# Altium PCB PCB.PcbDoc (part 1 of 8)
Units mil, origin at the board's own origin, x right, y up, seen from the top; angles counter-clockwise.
Board outline 11229.24 x 7764.43 mil, 14 copper layers (Top Layer, GND1, Signal 1, GND2, Signal 2, GND3, Singal 3, Power 1, GND4, Power 2, GND5, Power 3, GND6, Bottom Layer), stack 91.892 mil thick; 877 components, 305 nets, 2660 pads, 2851 vias.
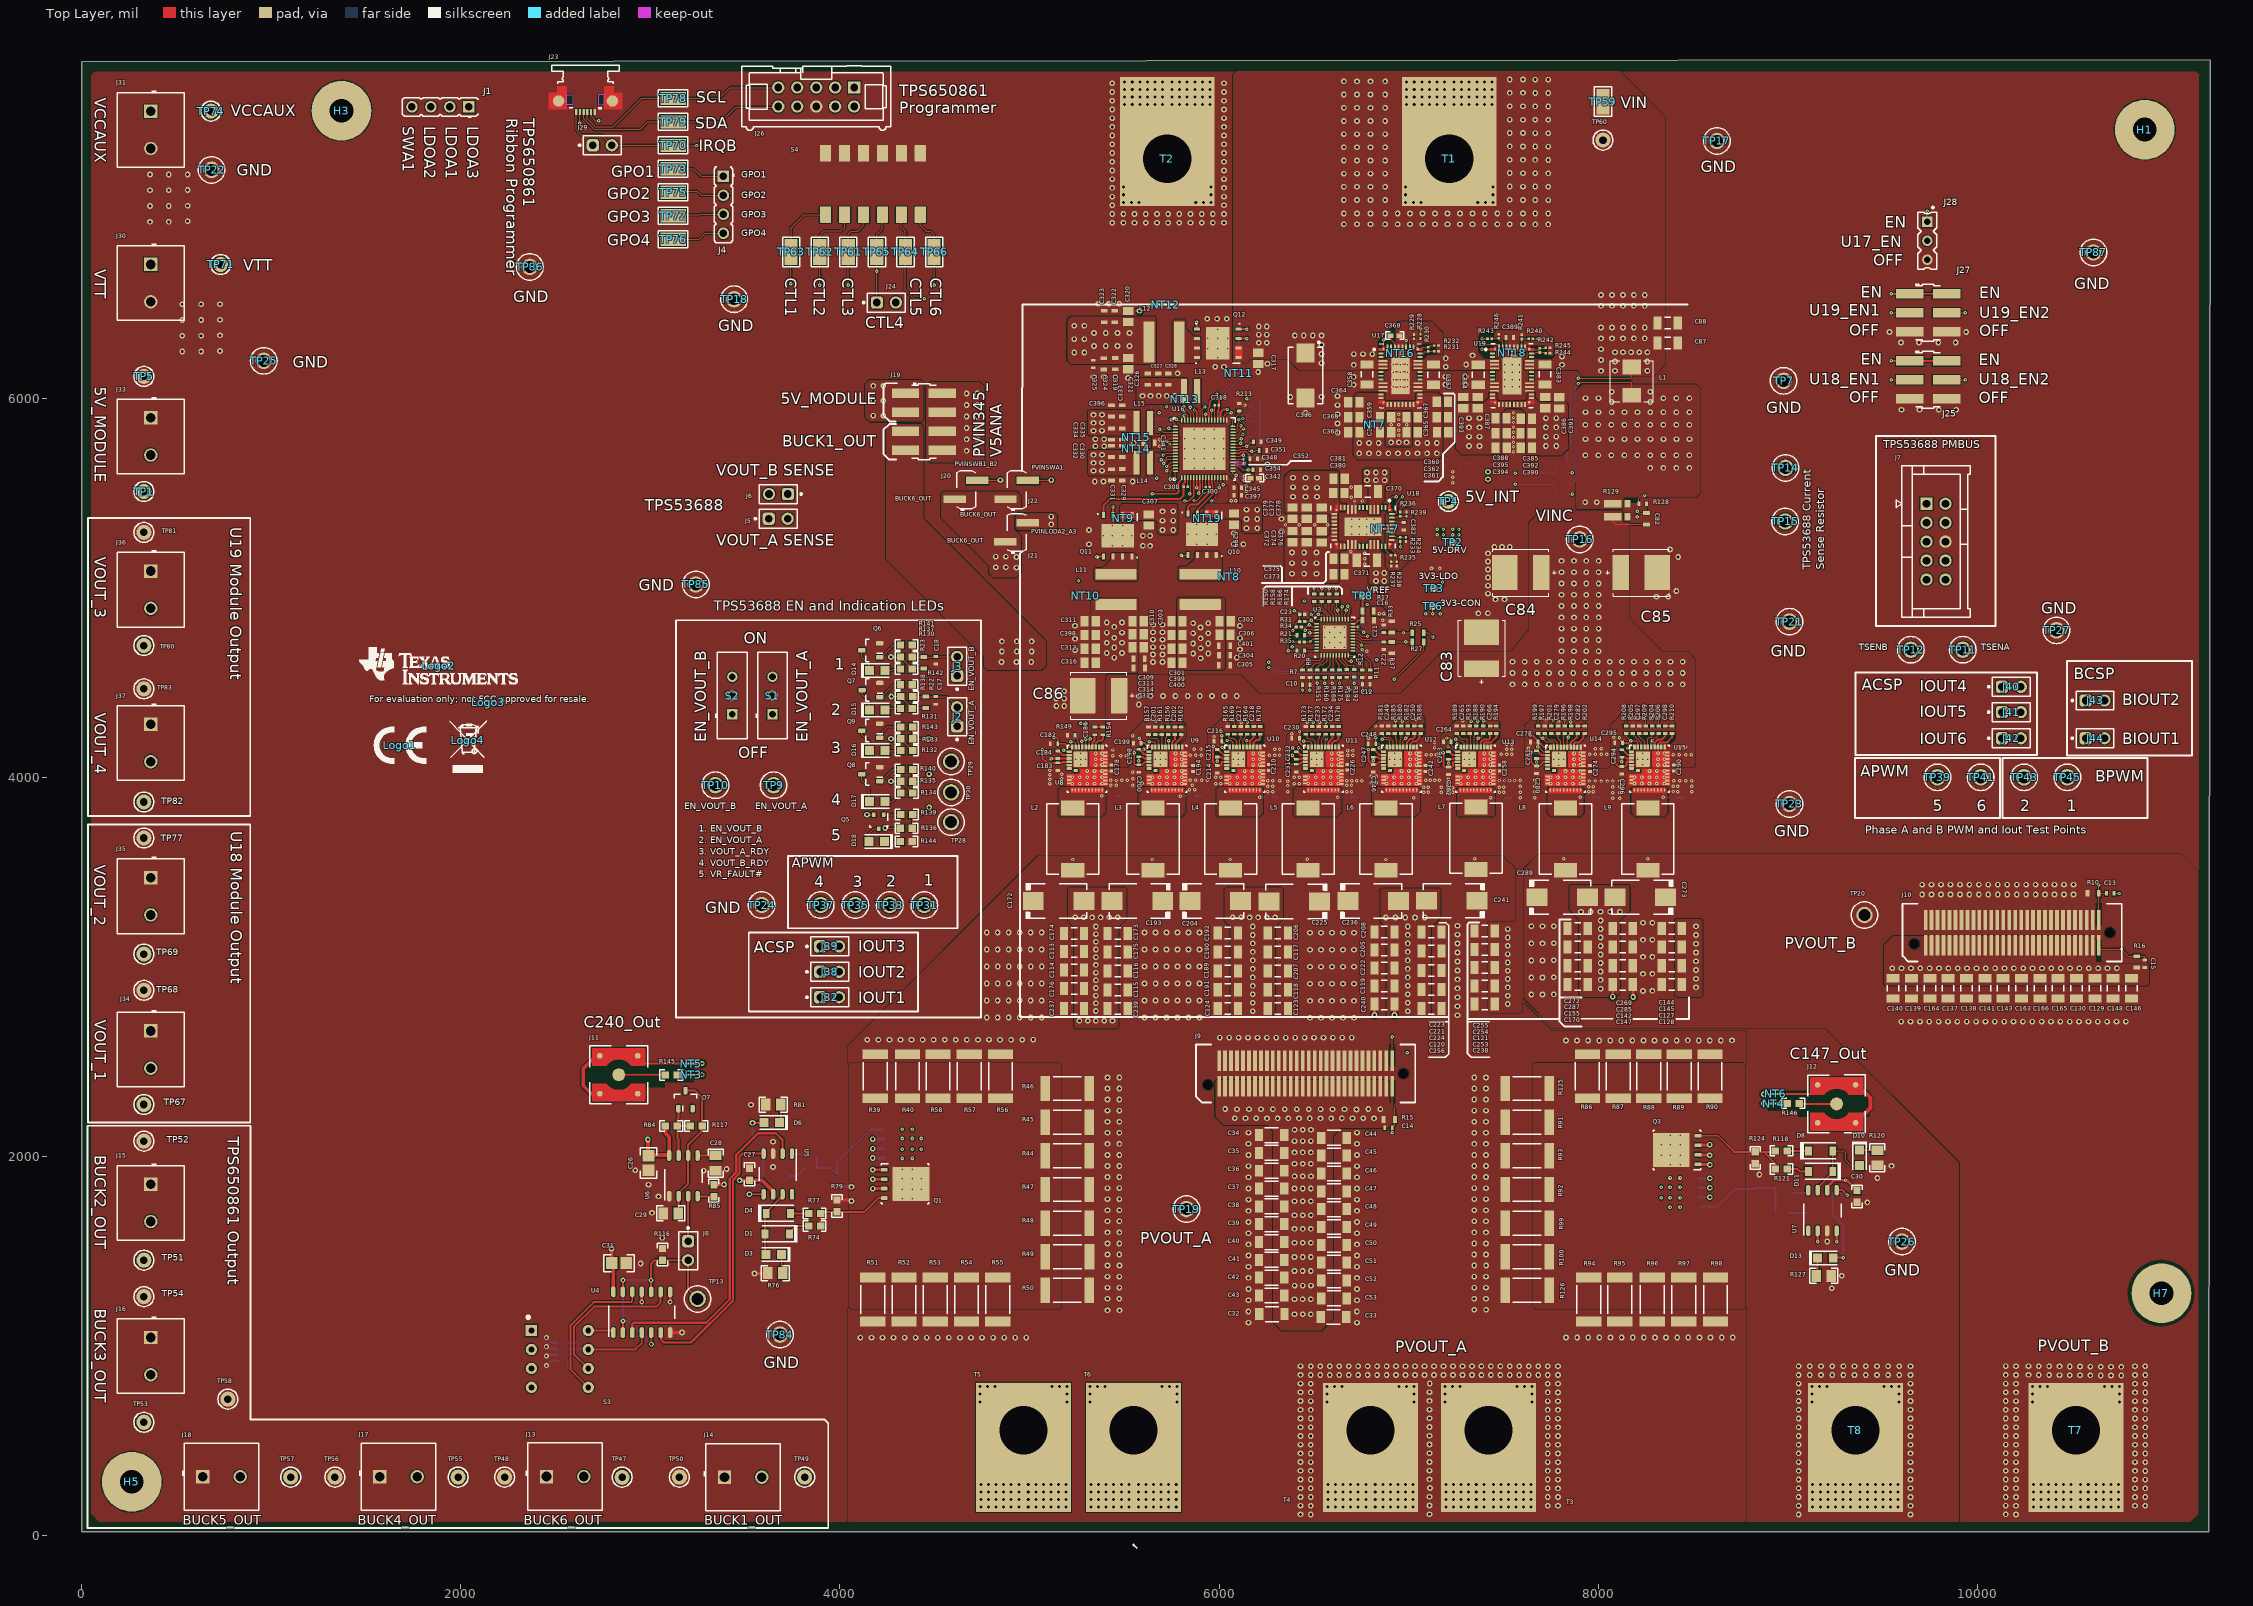
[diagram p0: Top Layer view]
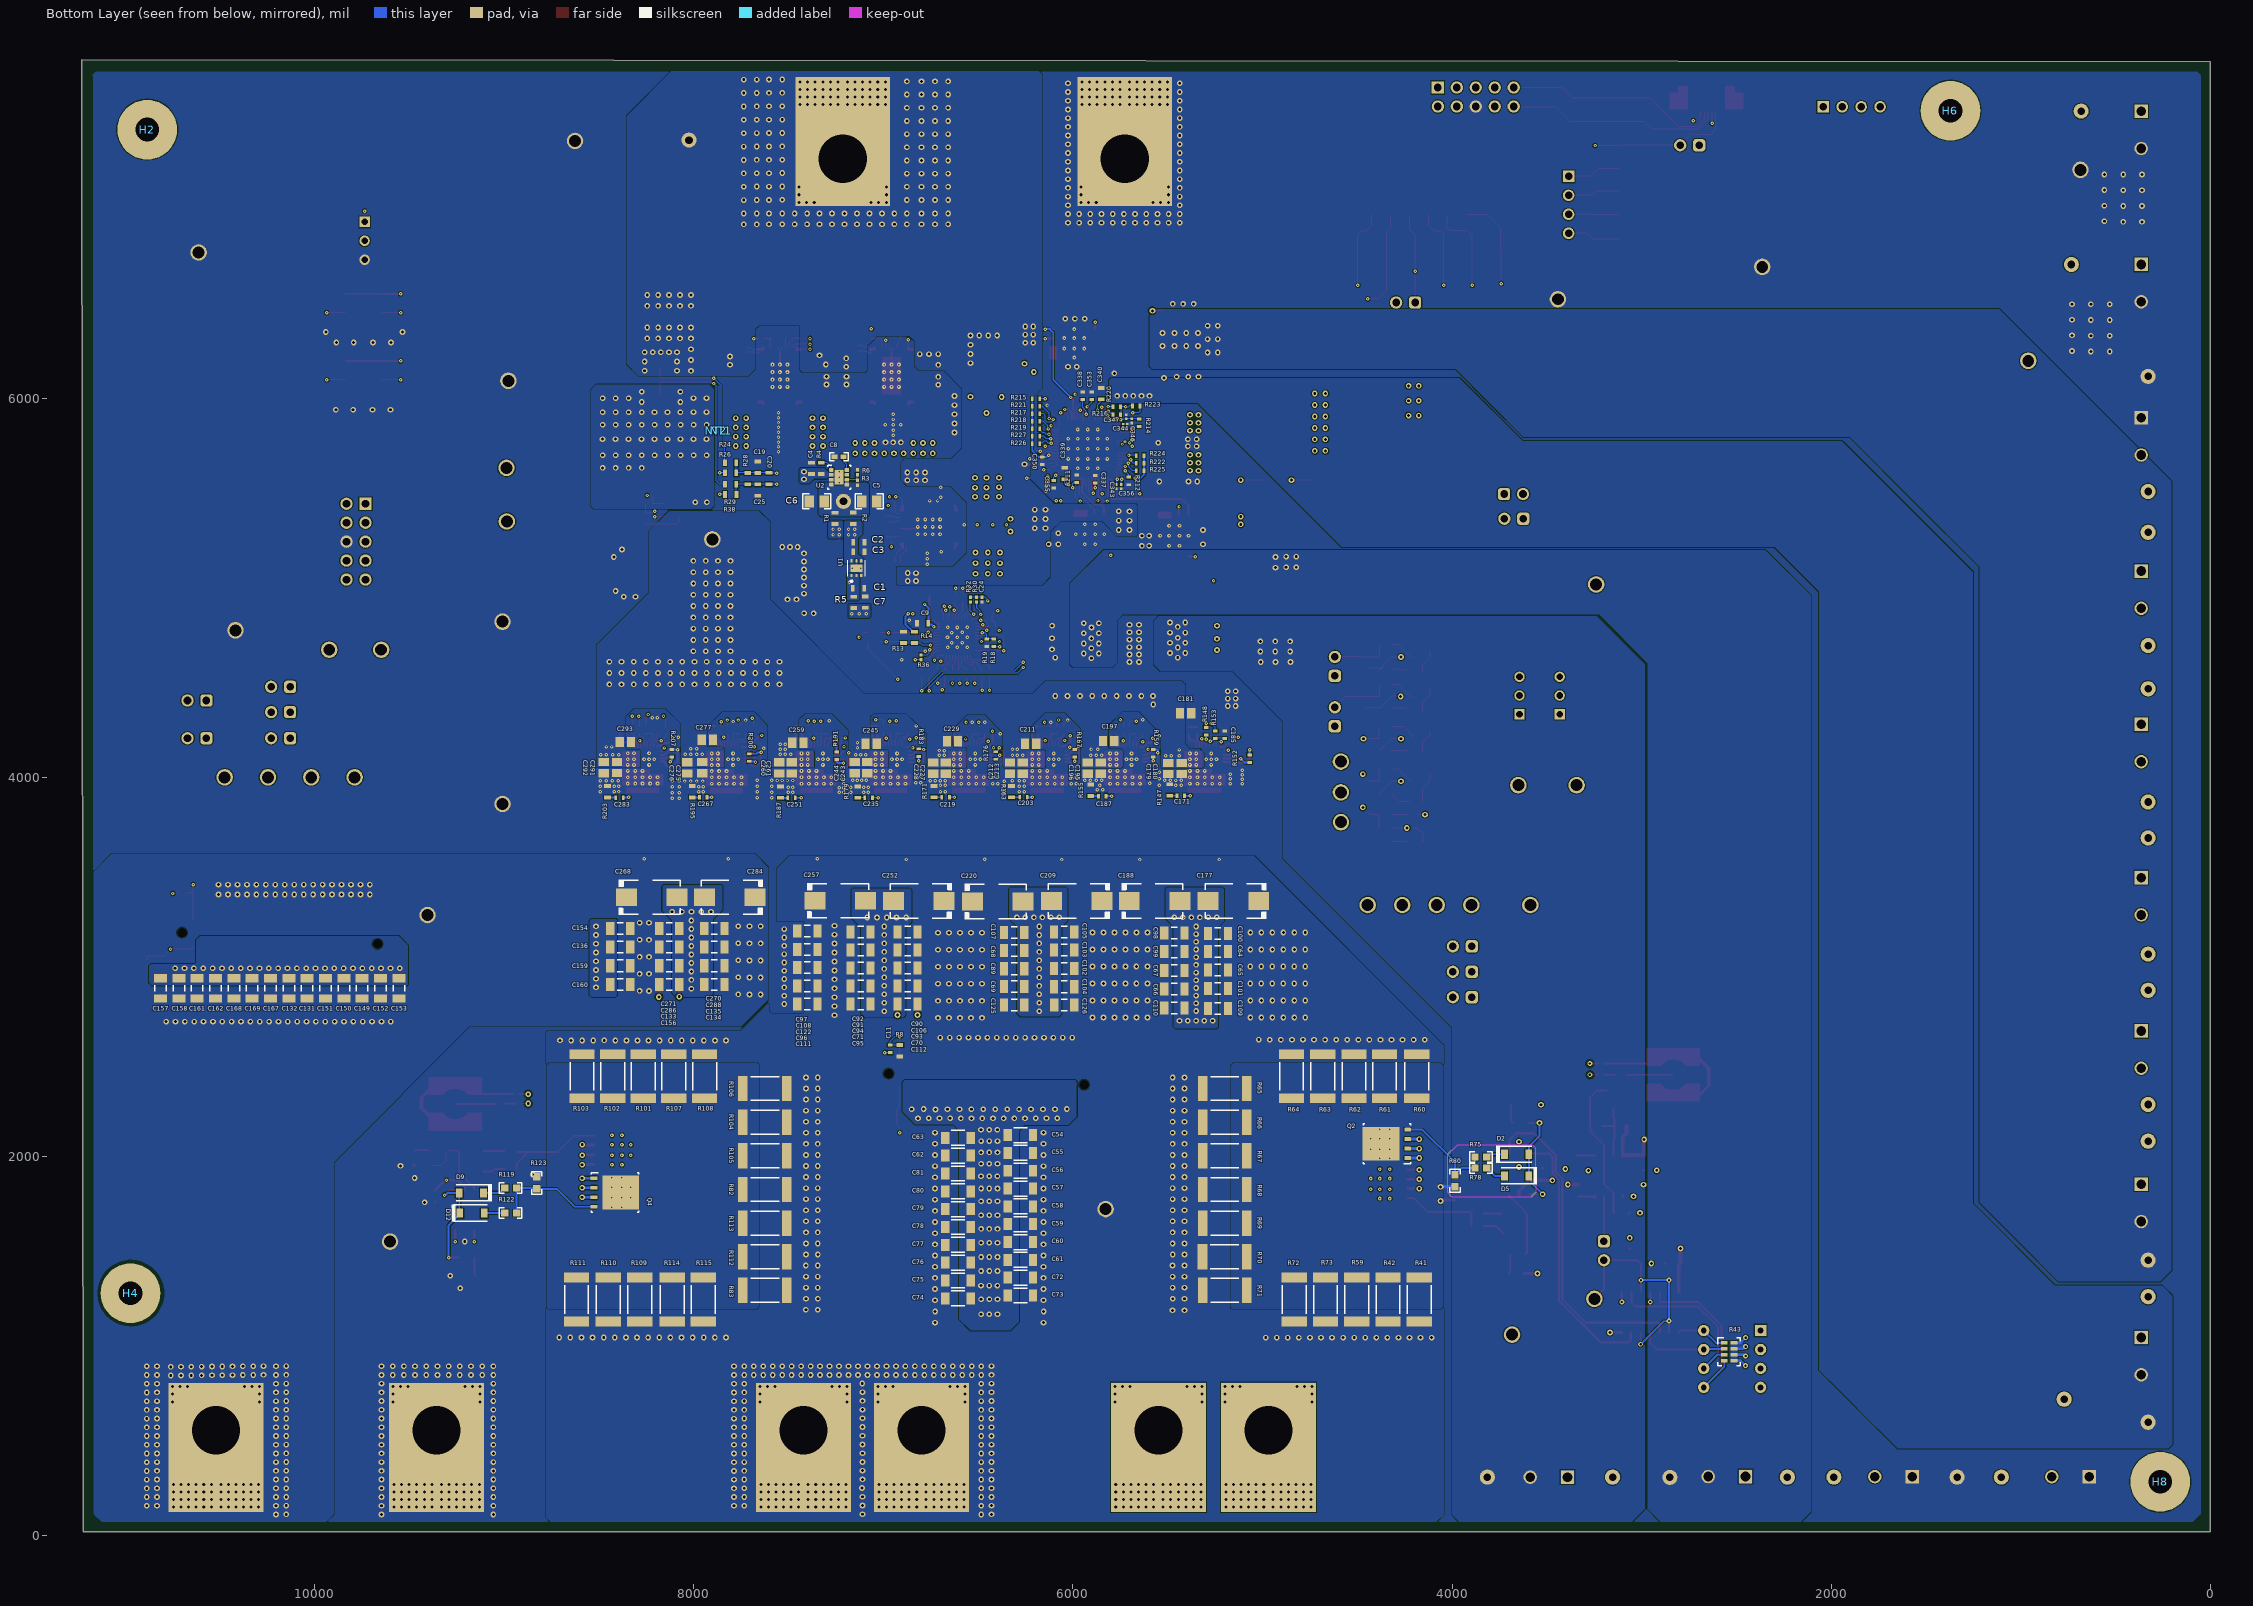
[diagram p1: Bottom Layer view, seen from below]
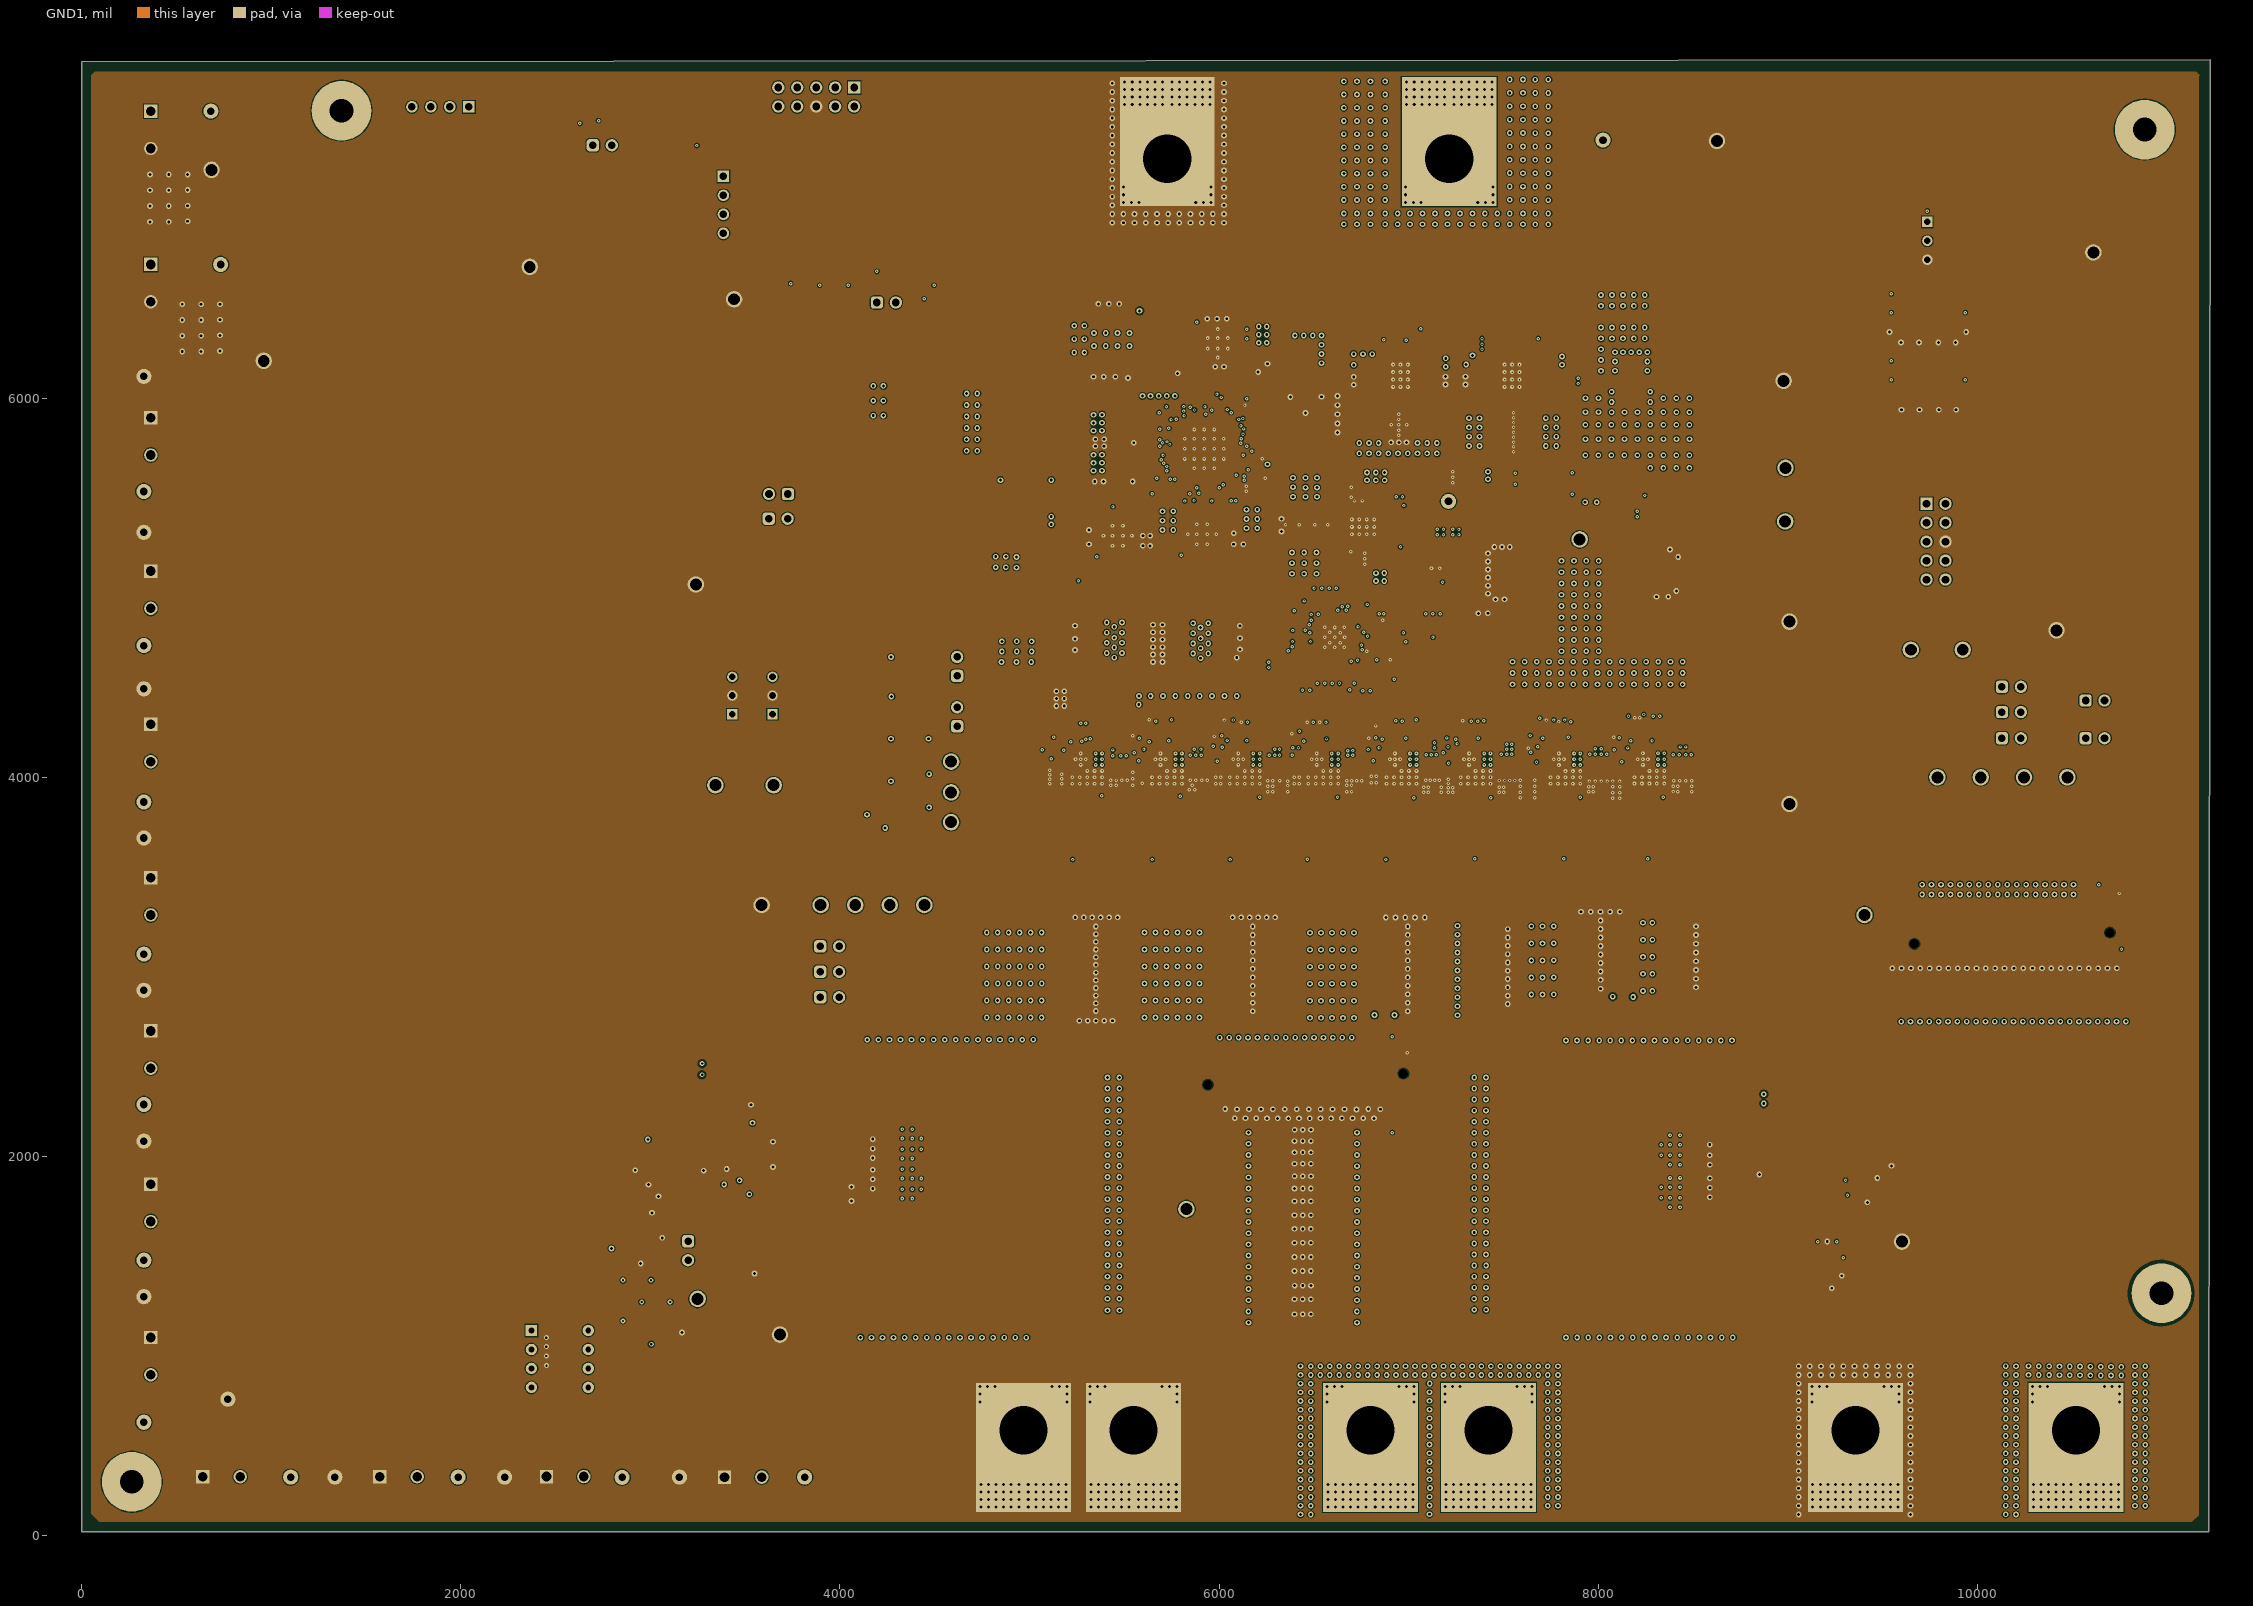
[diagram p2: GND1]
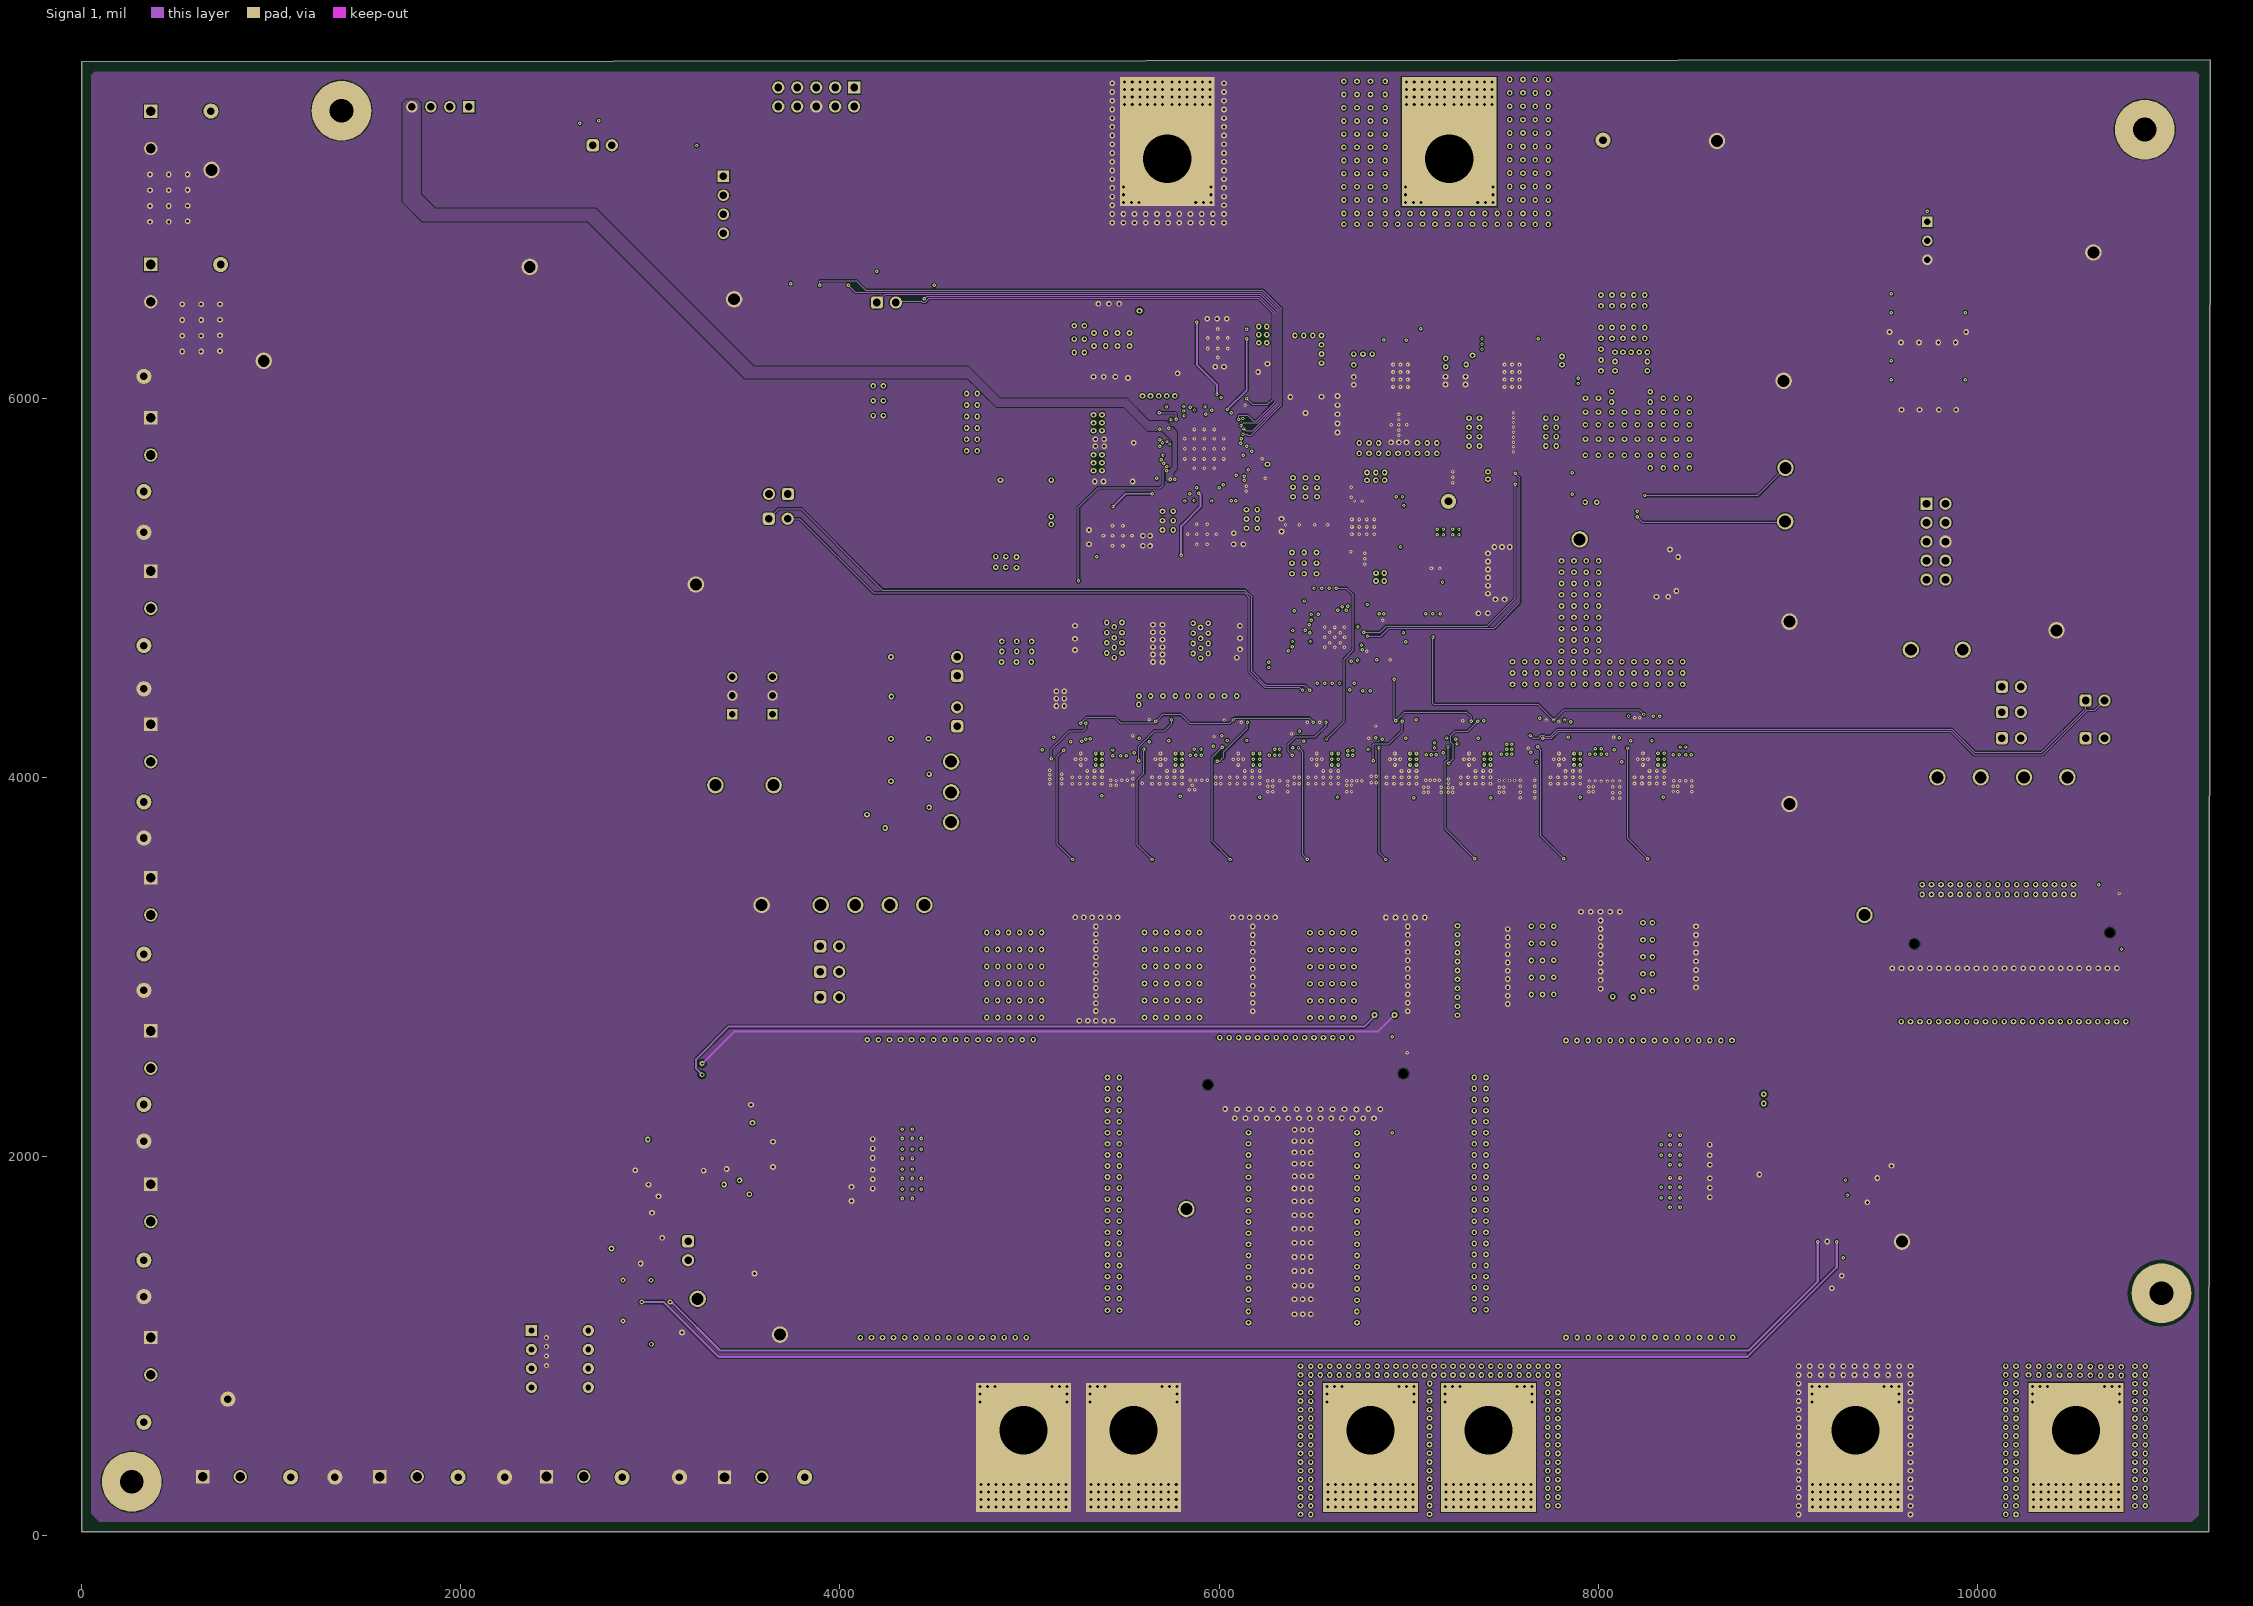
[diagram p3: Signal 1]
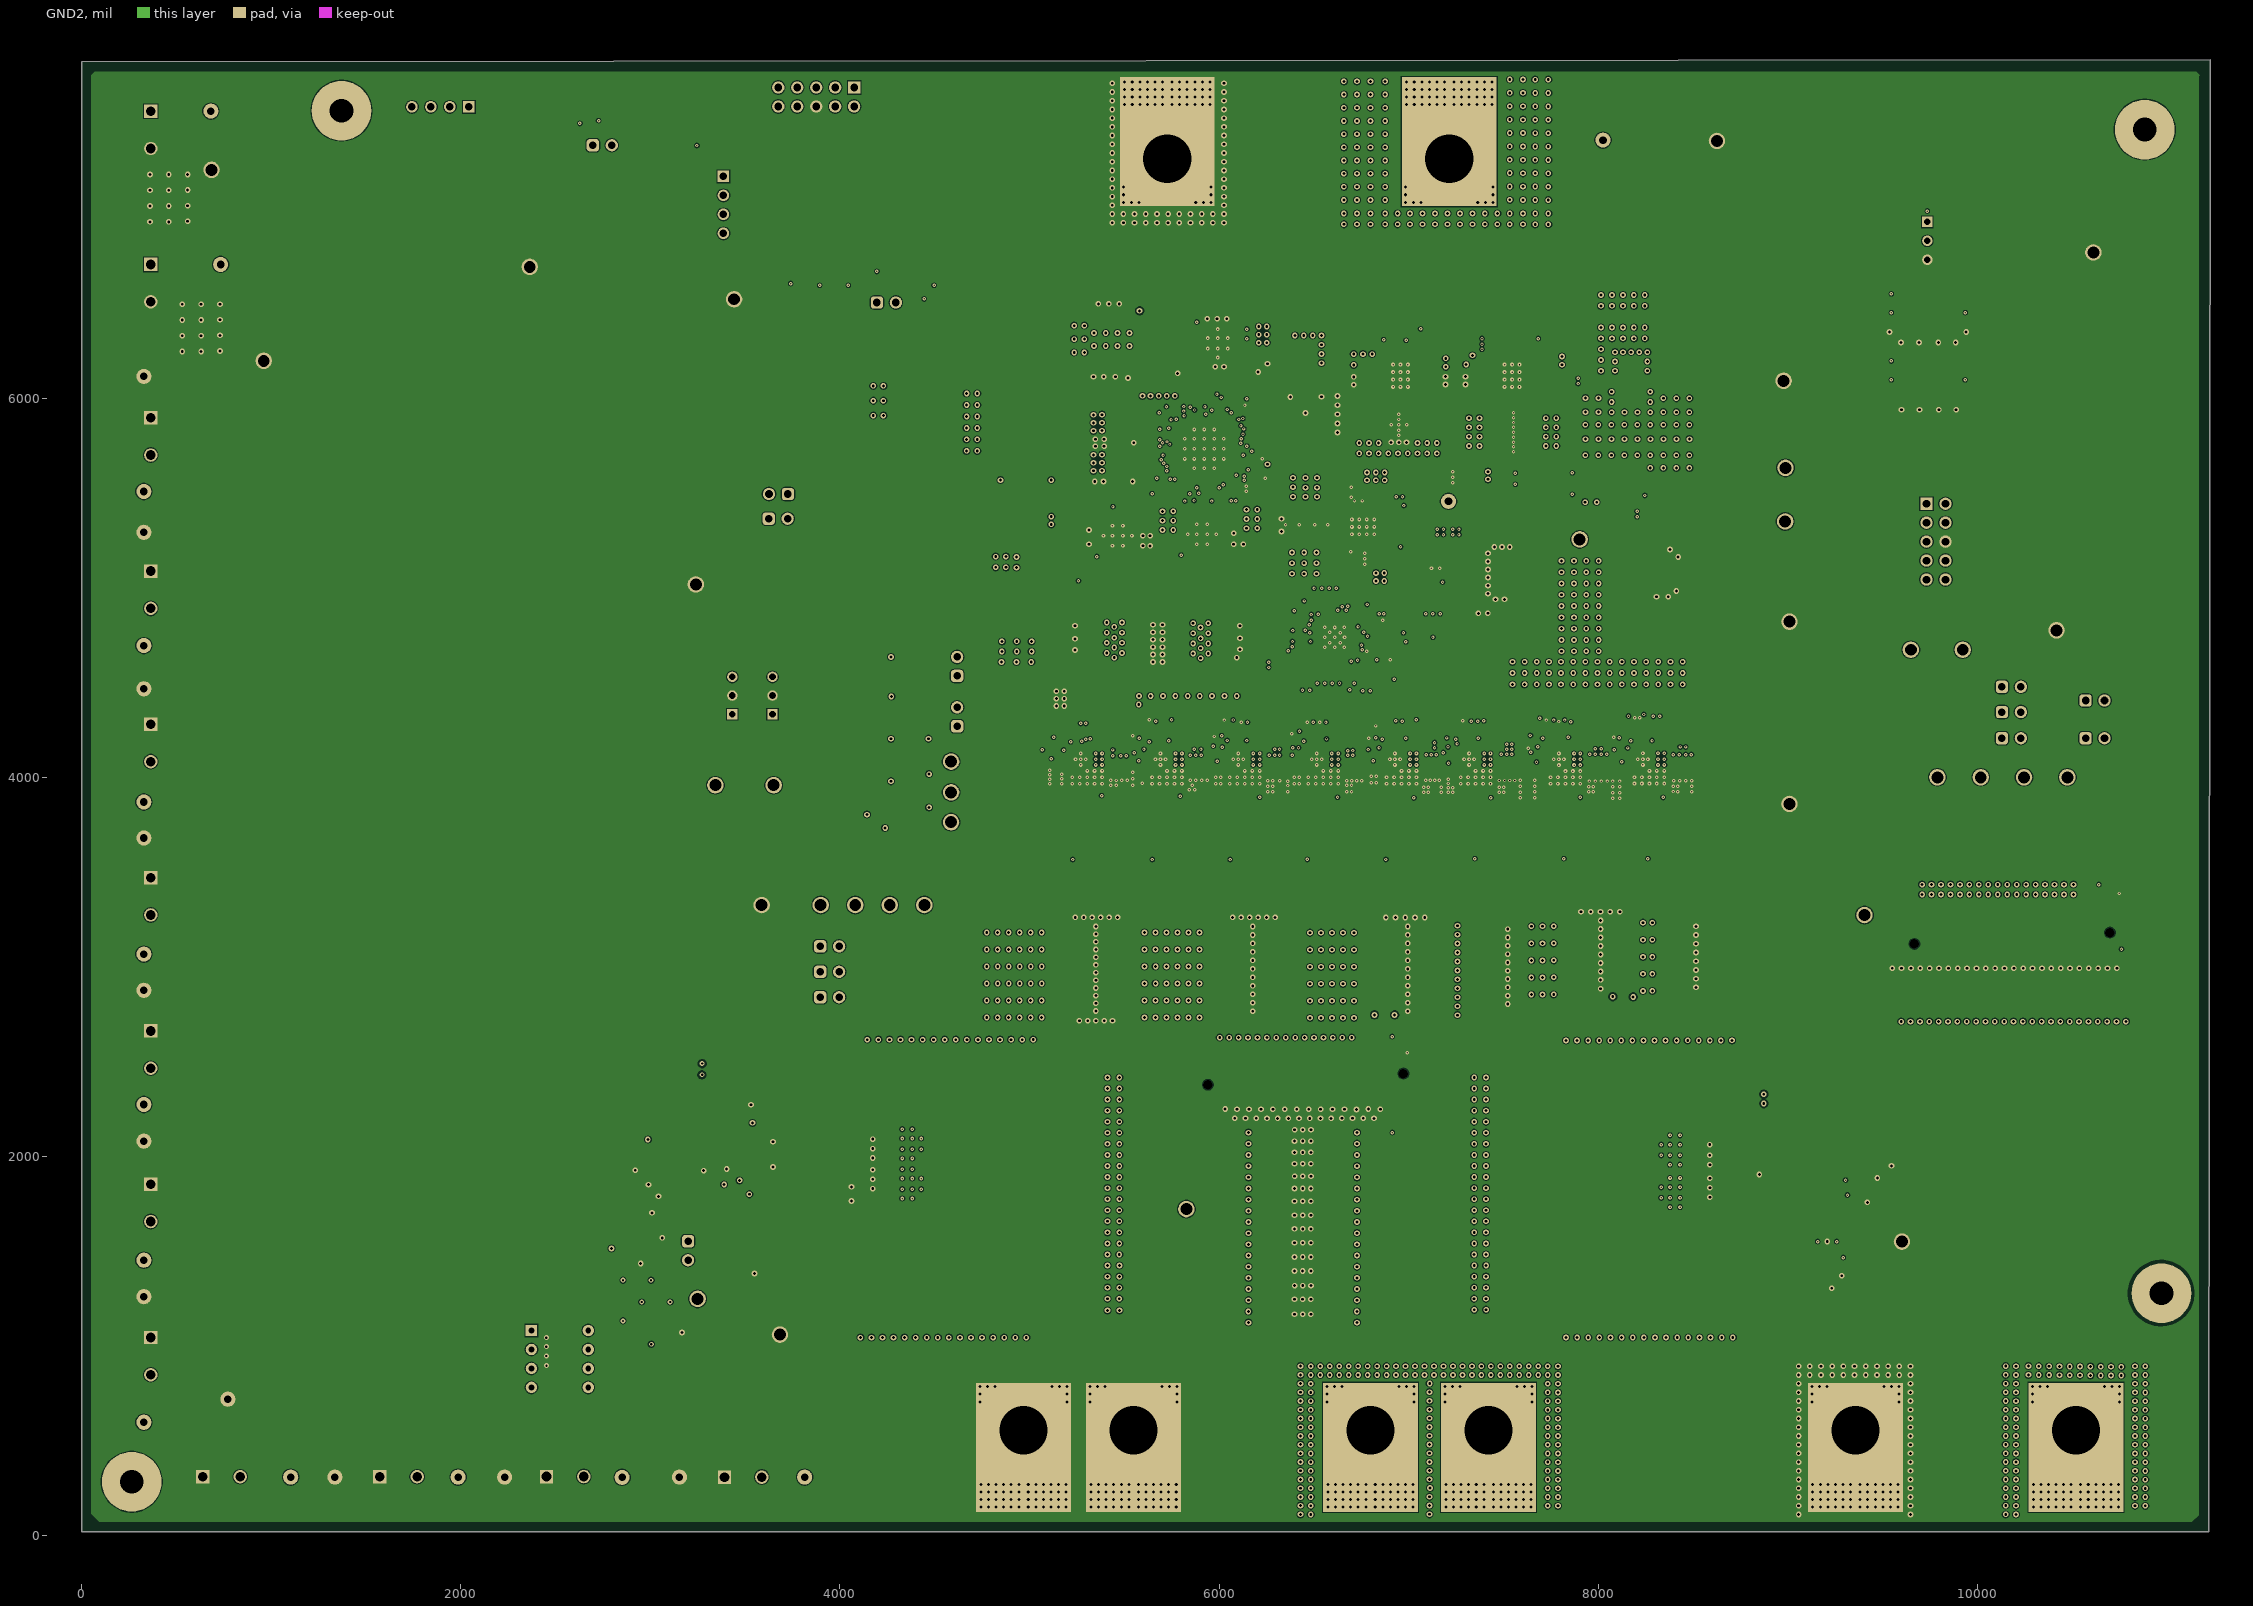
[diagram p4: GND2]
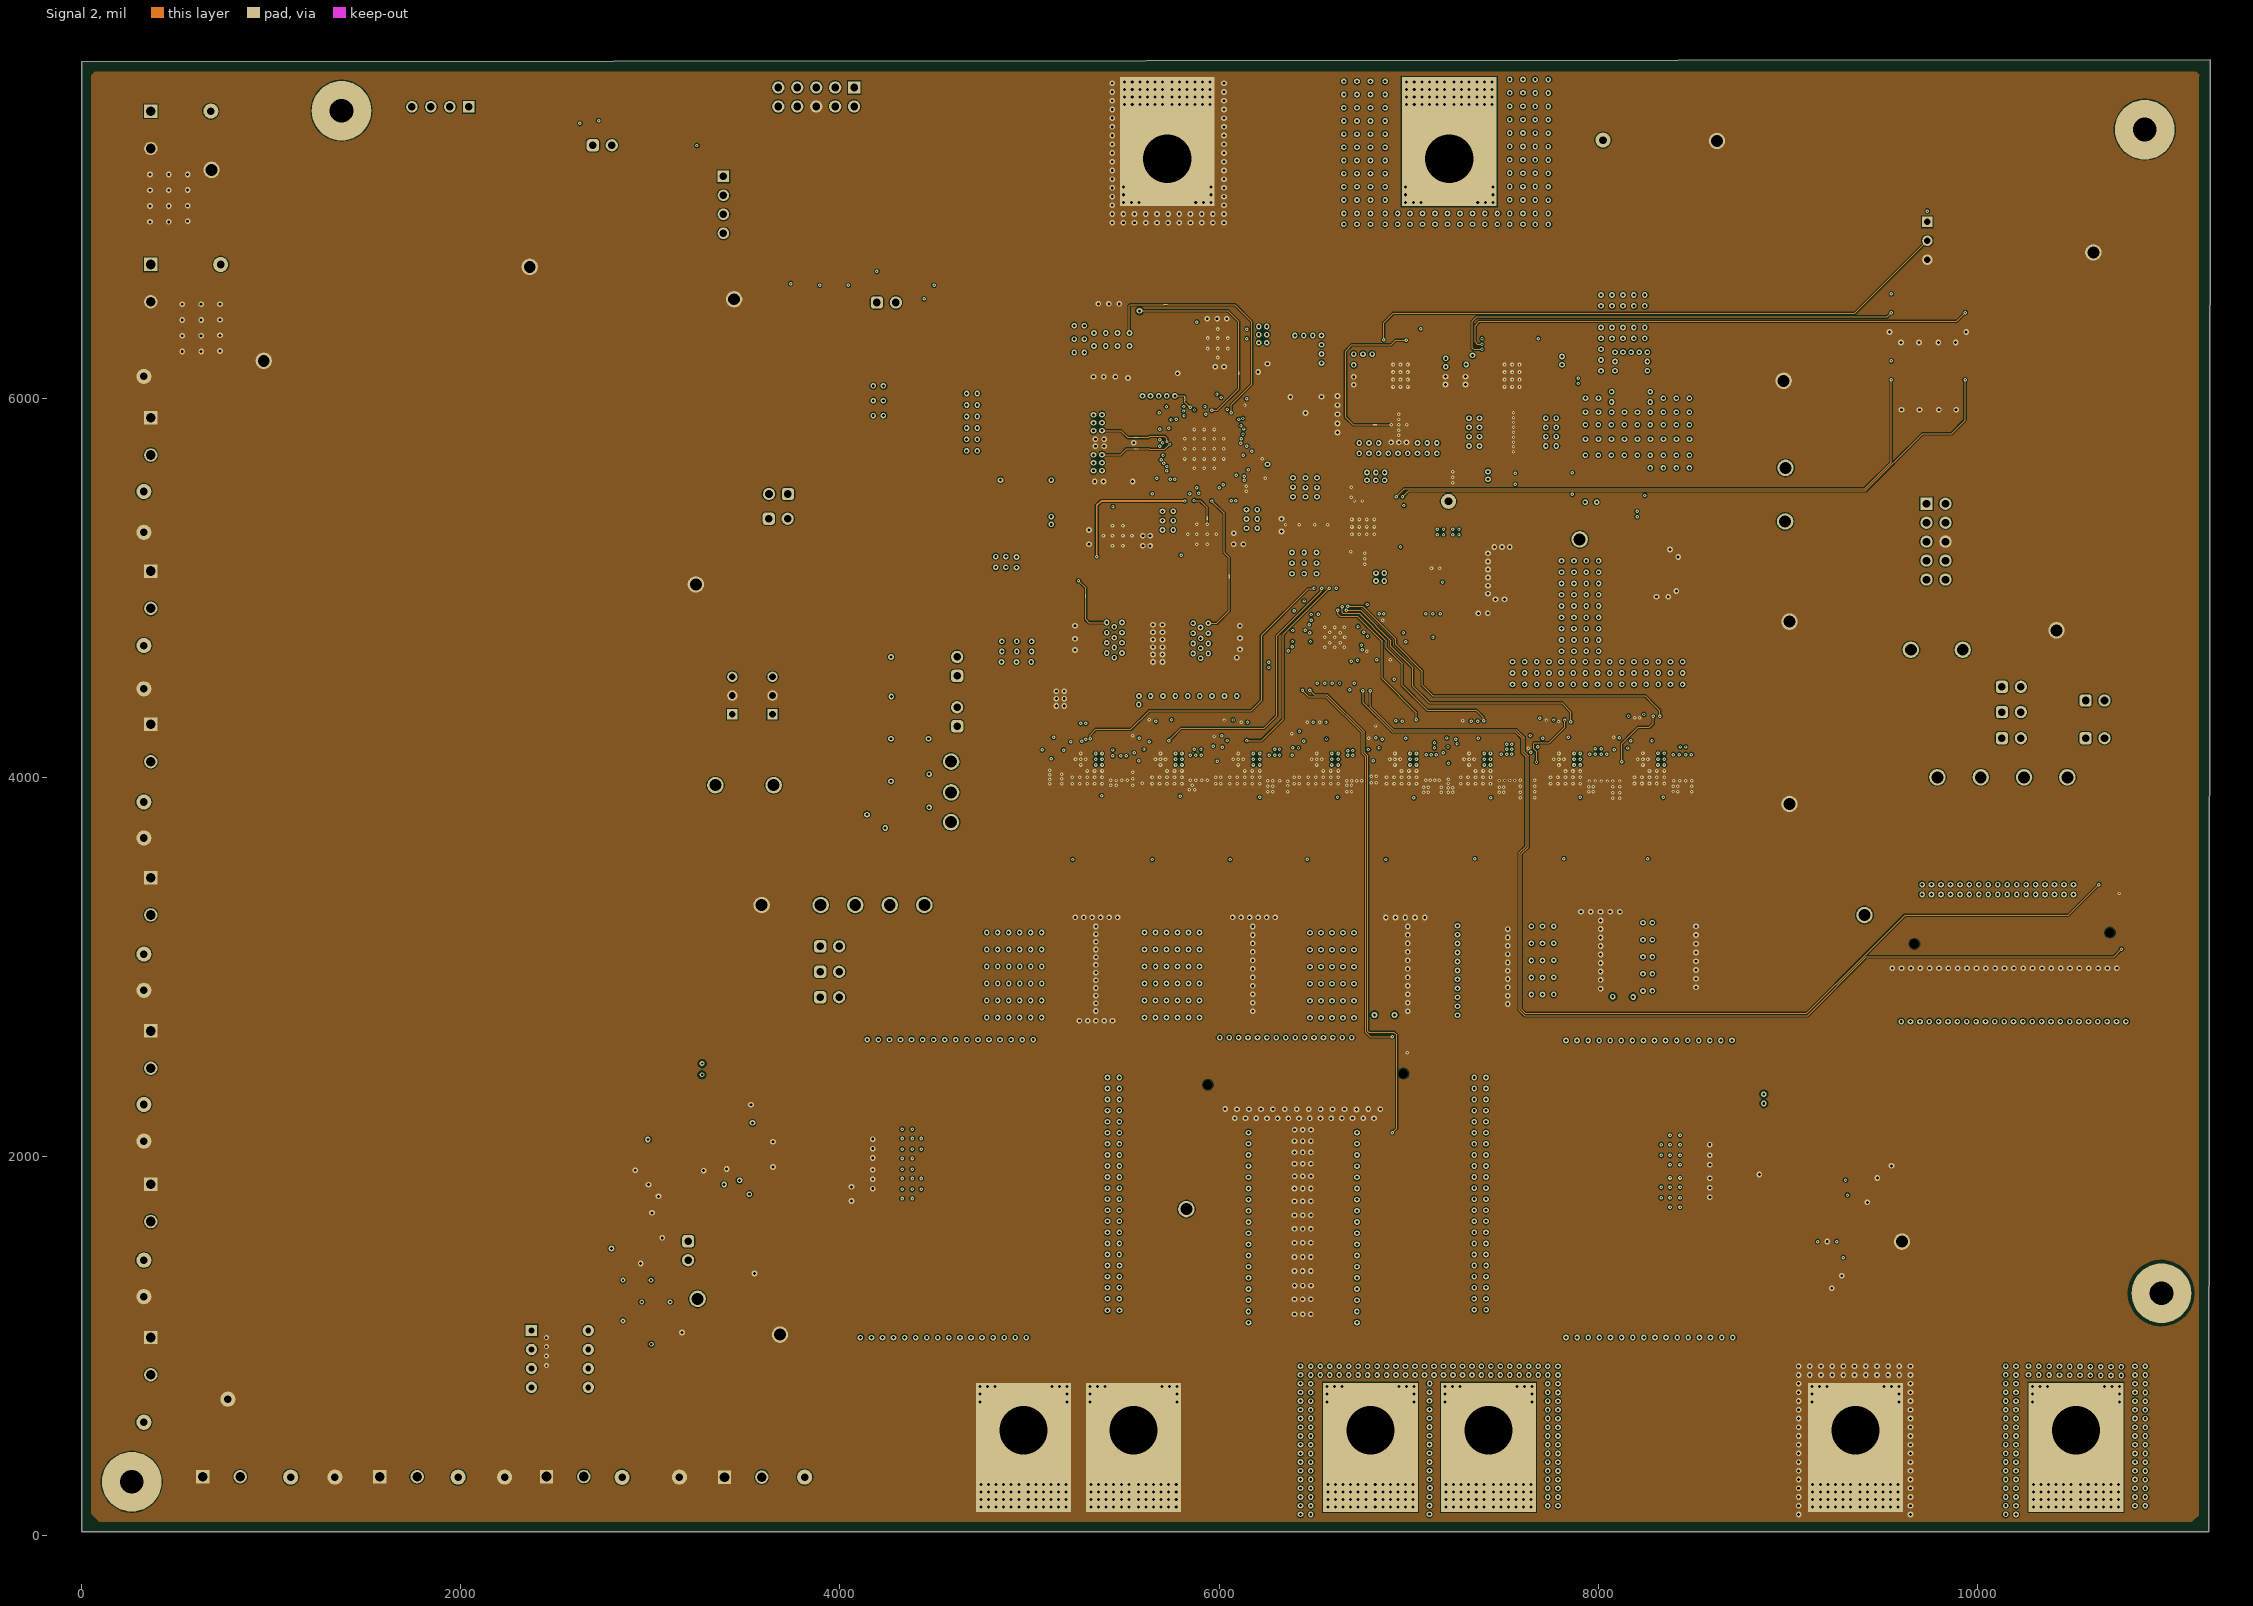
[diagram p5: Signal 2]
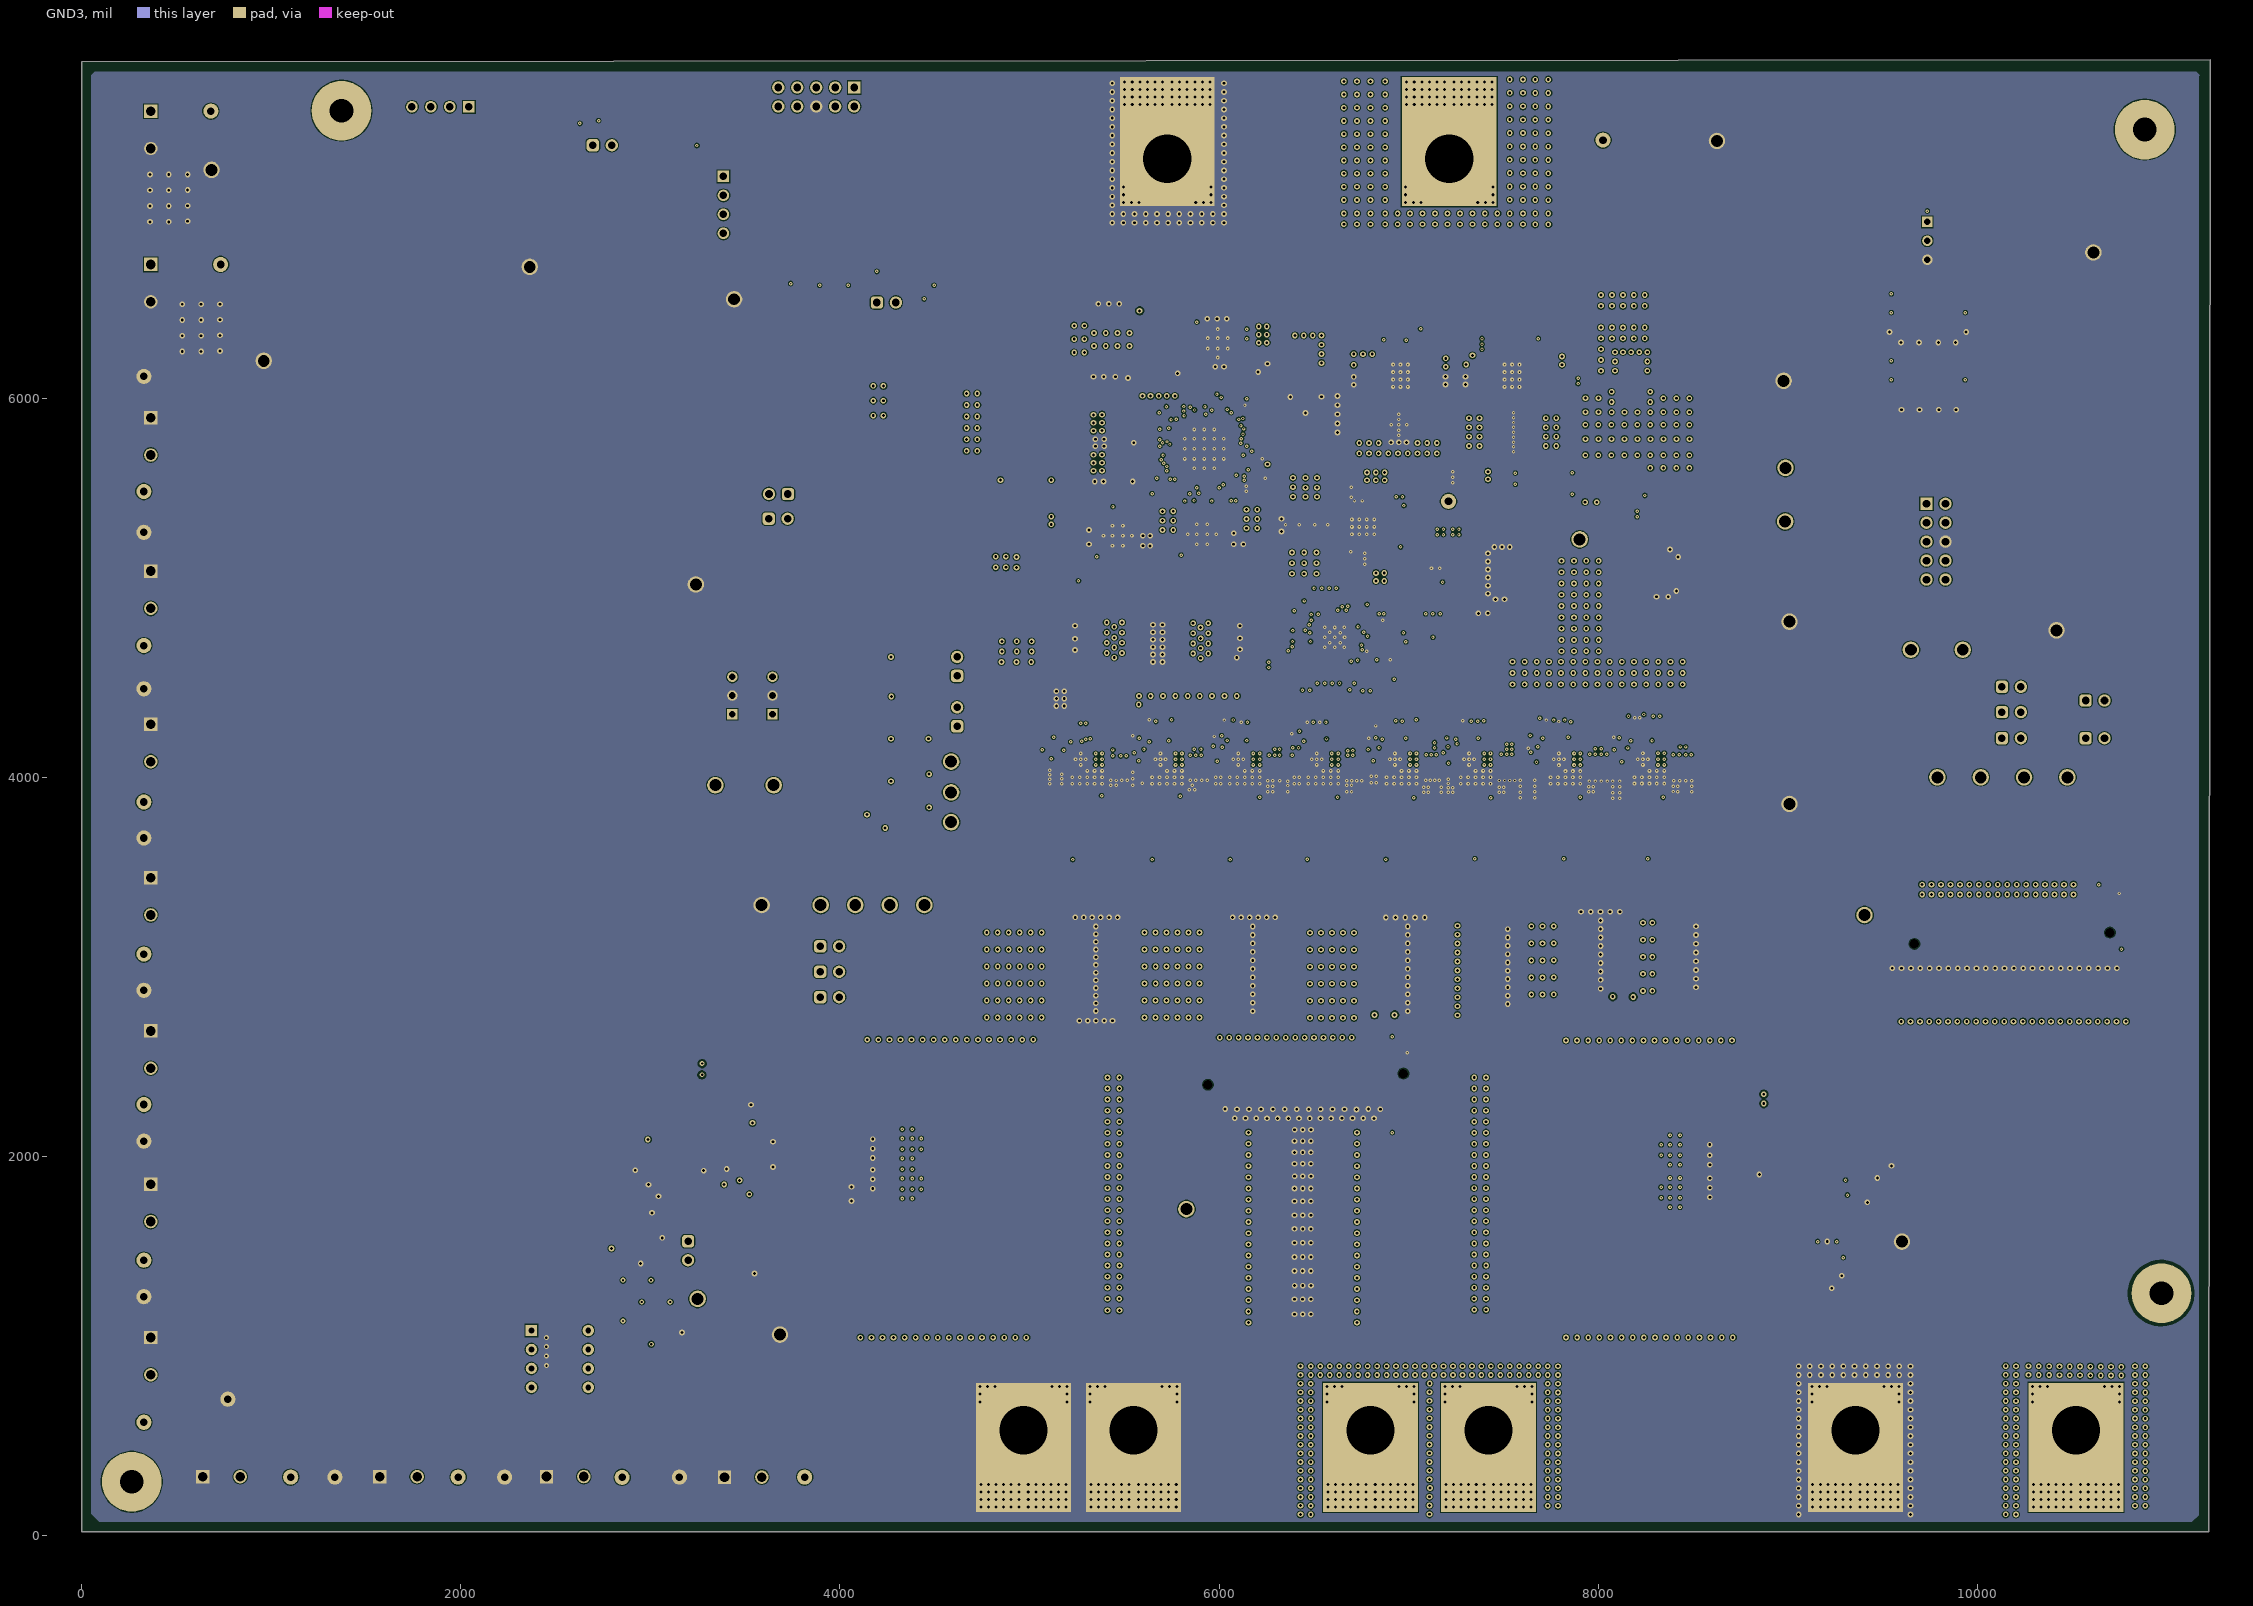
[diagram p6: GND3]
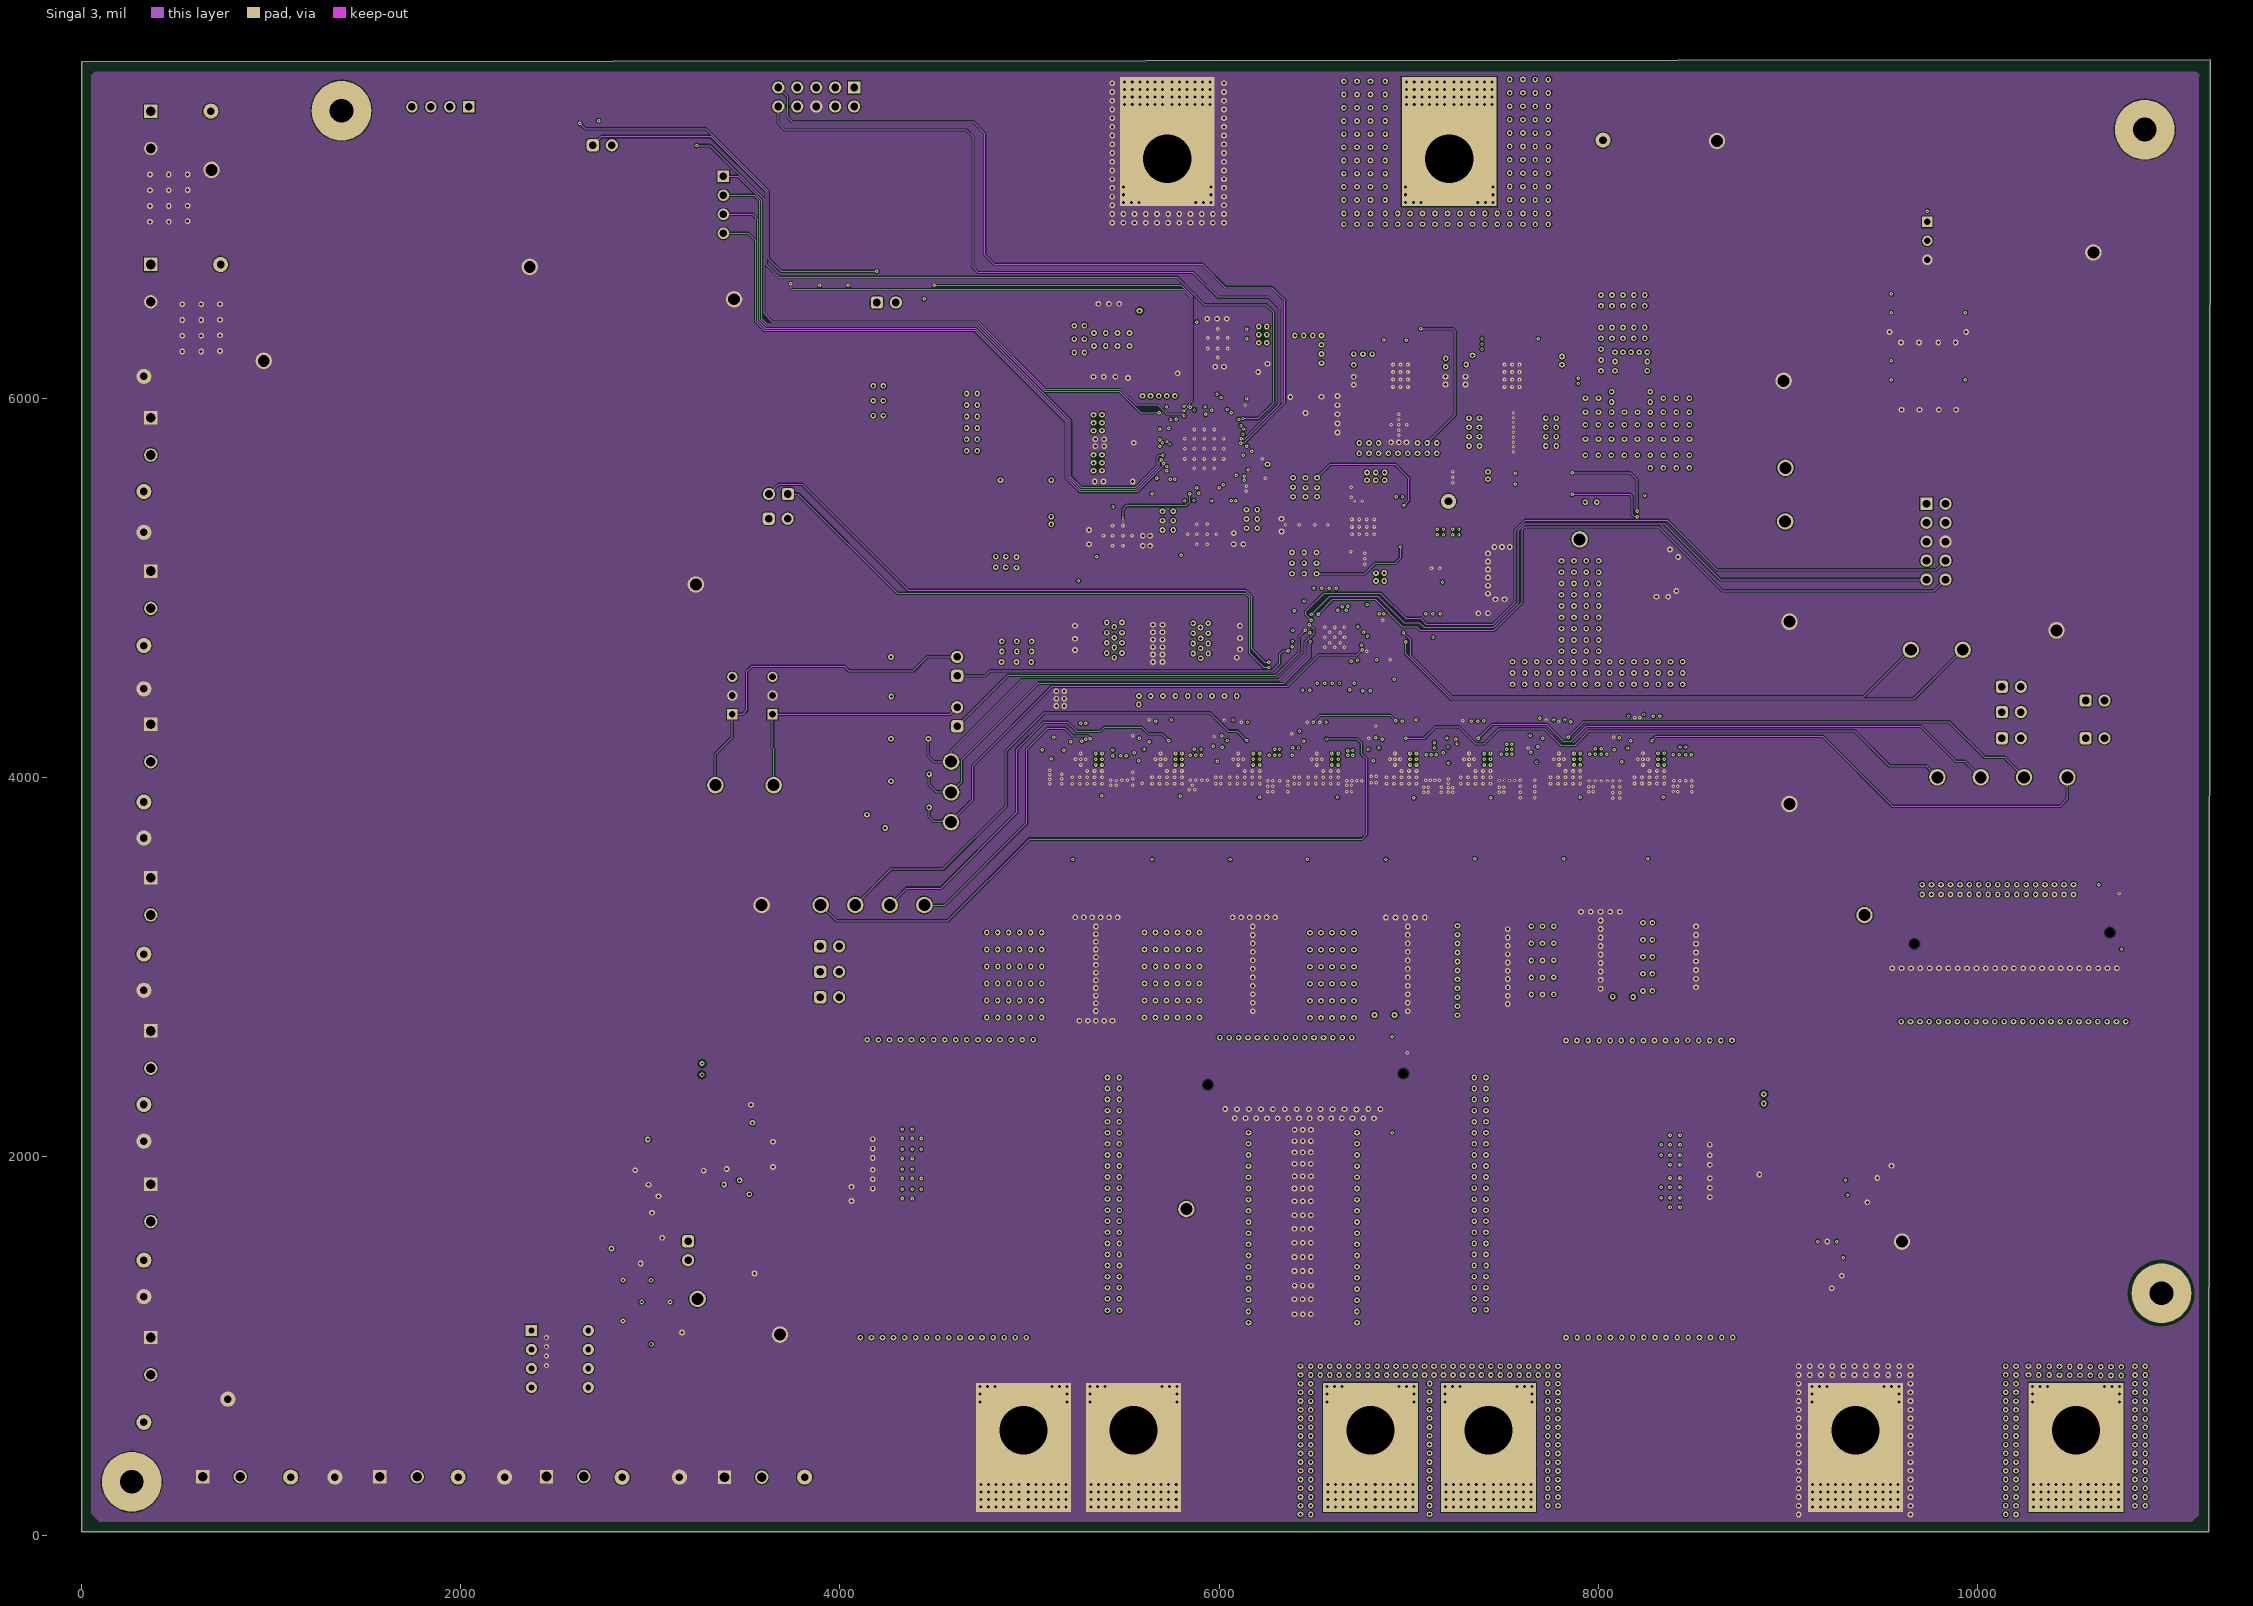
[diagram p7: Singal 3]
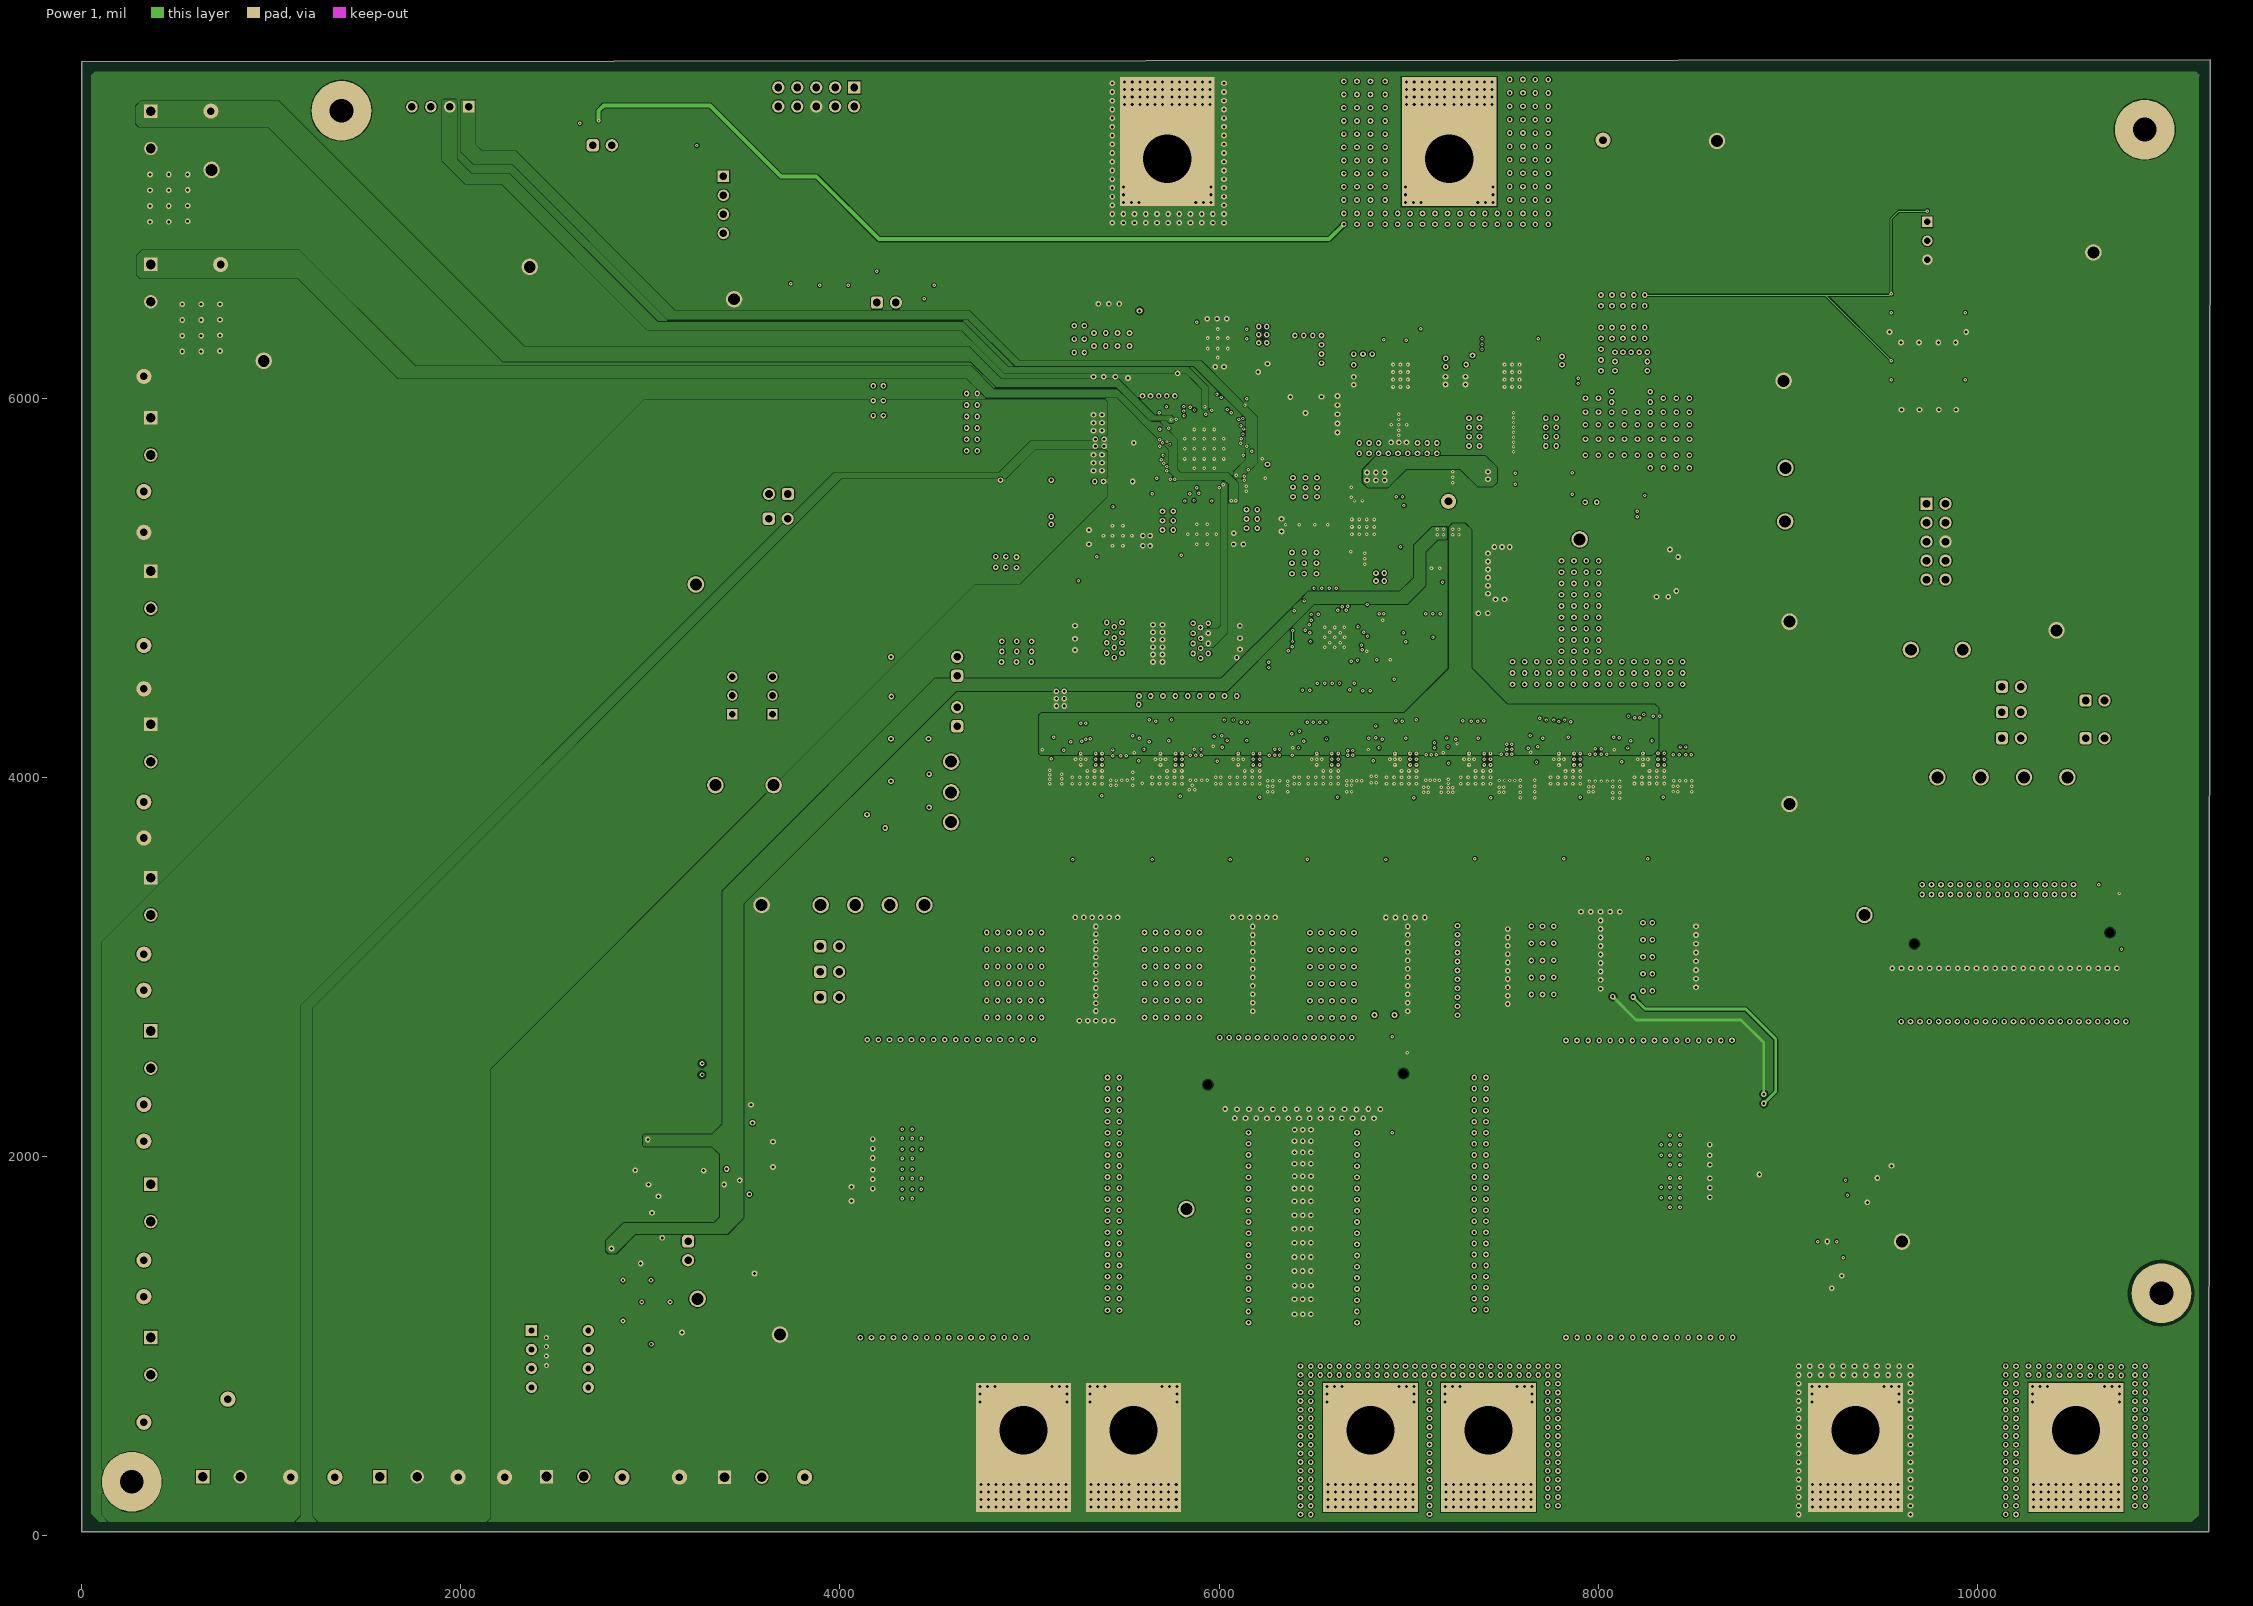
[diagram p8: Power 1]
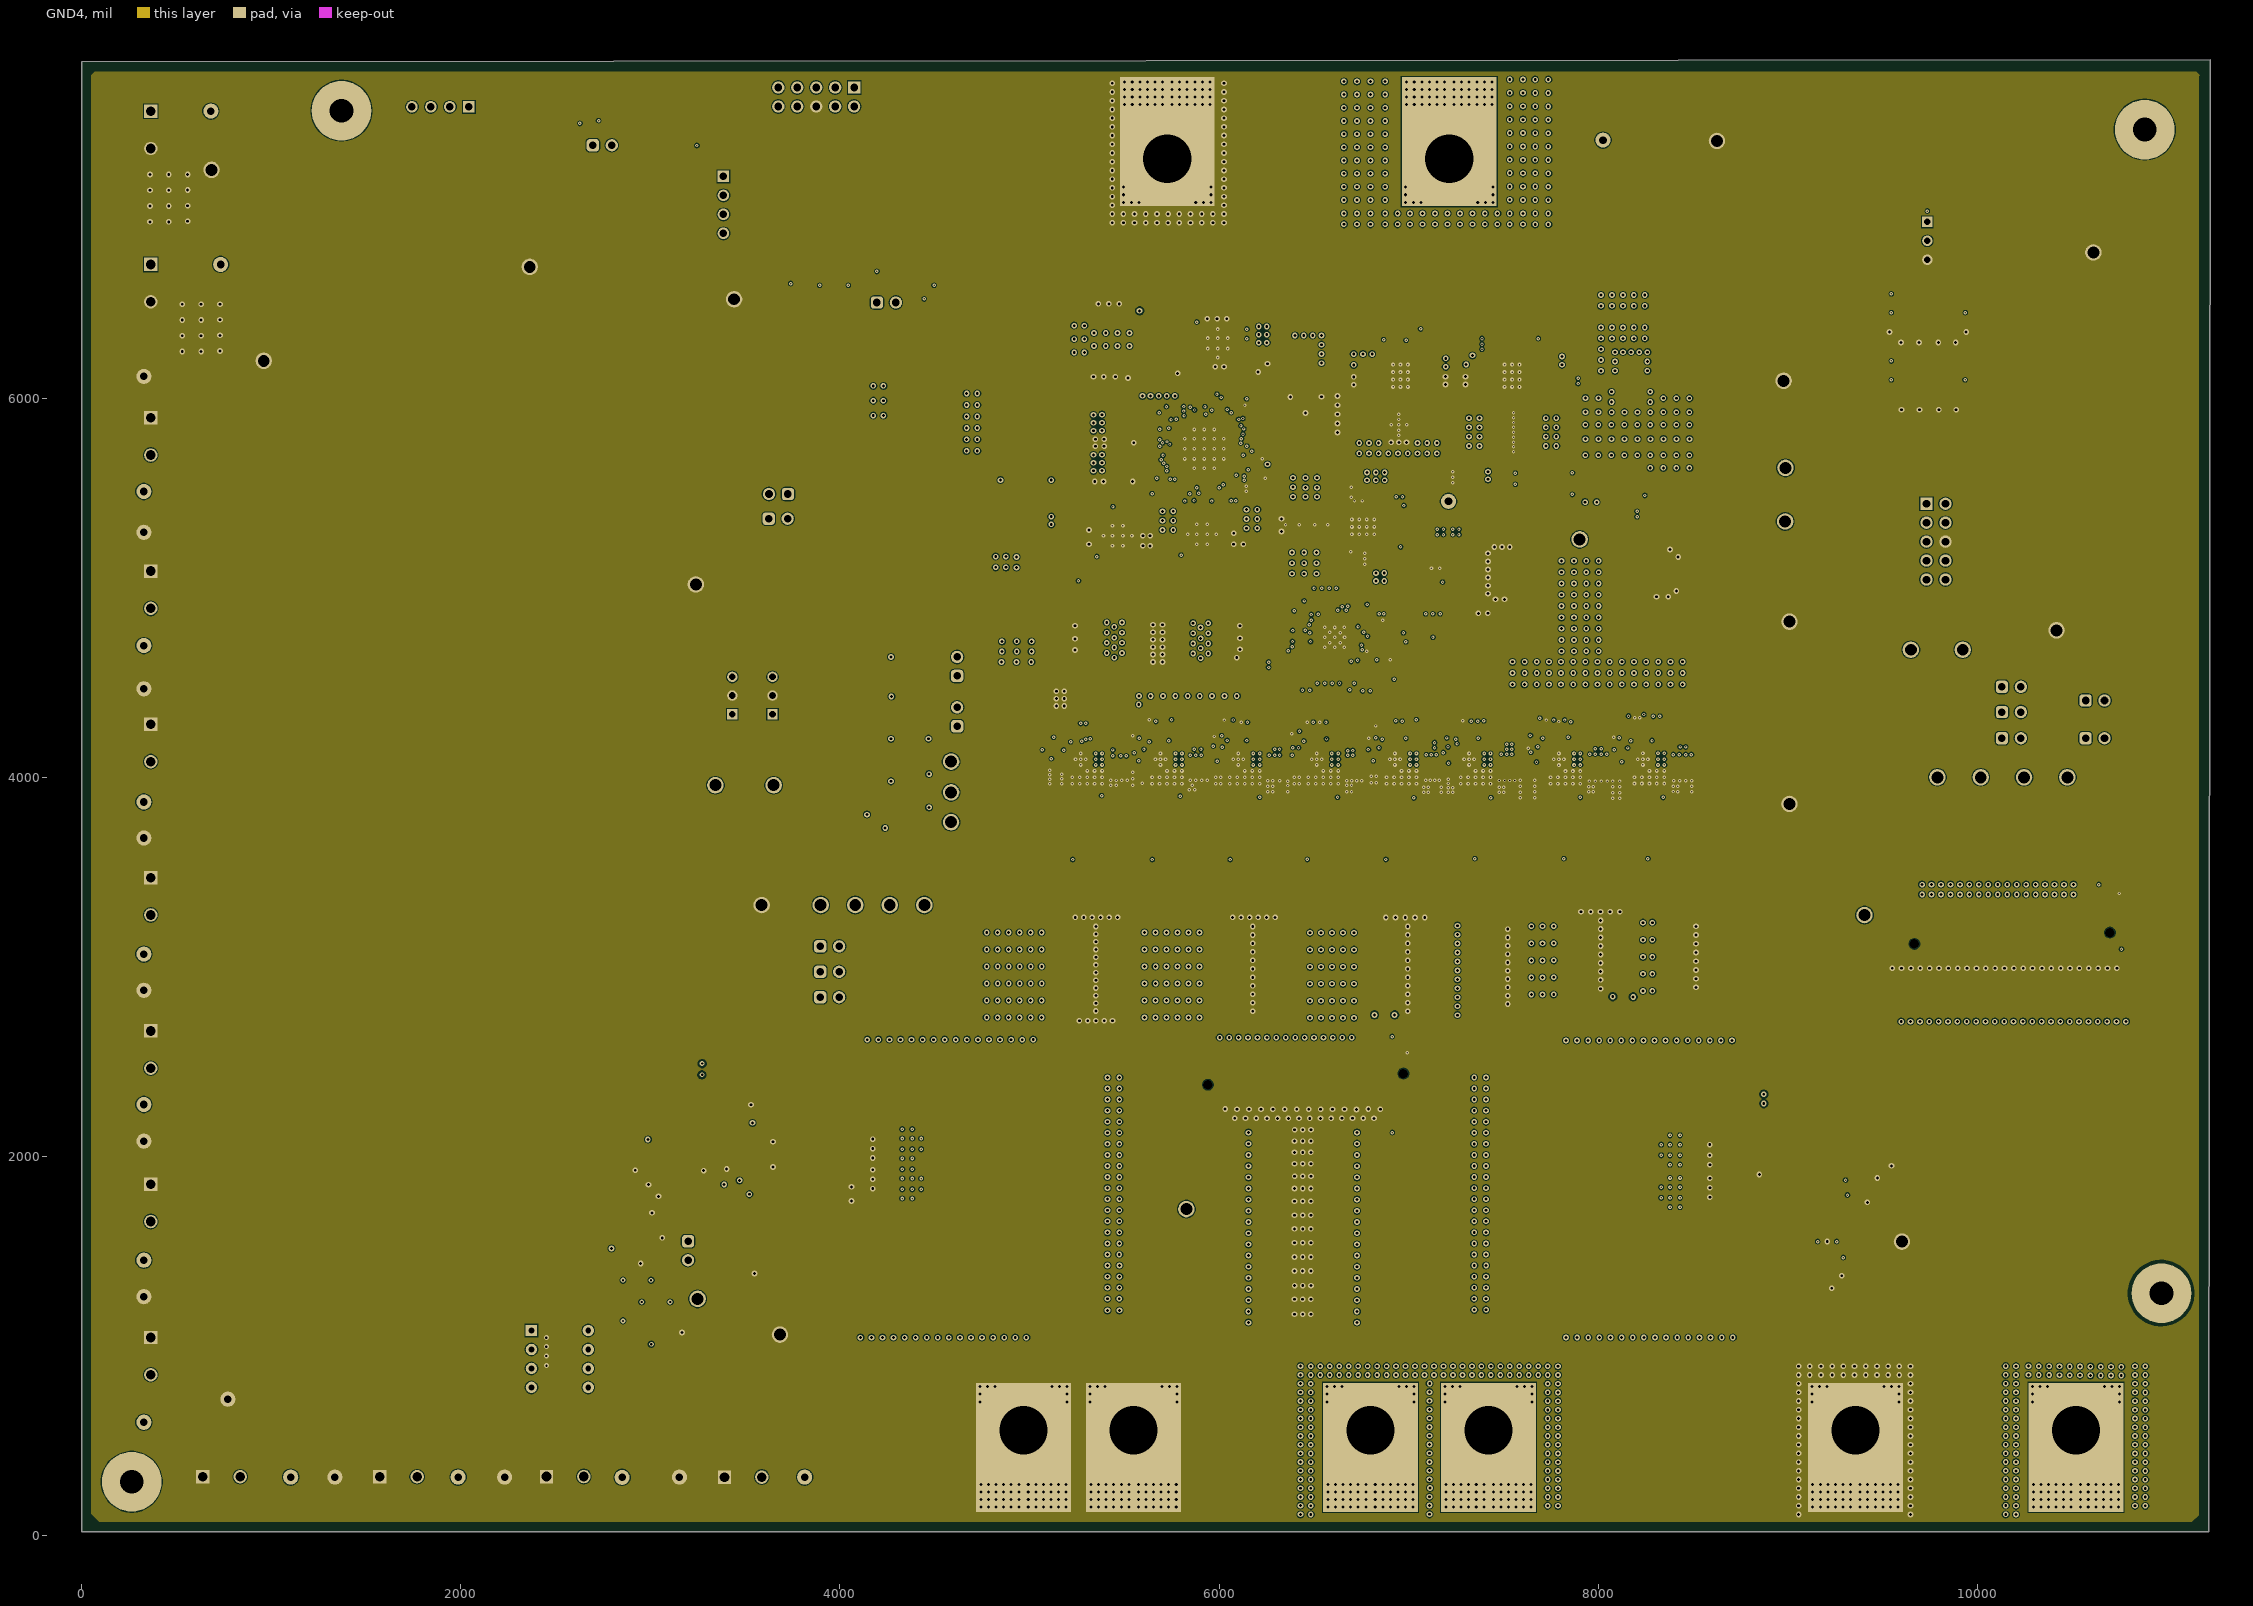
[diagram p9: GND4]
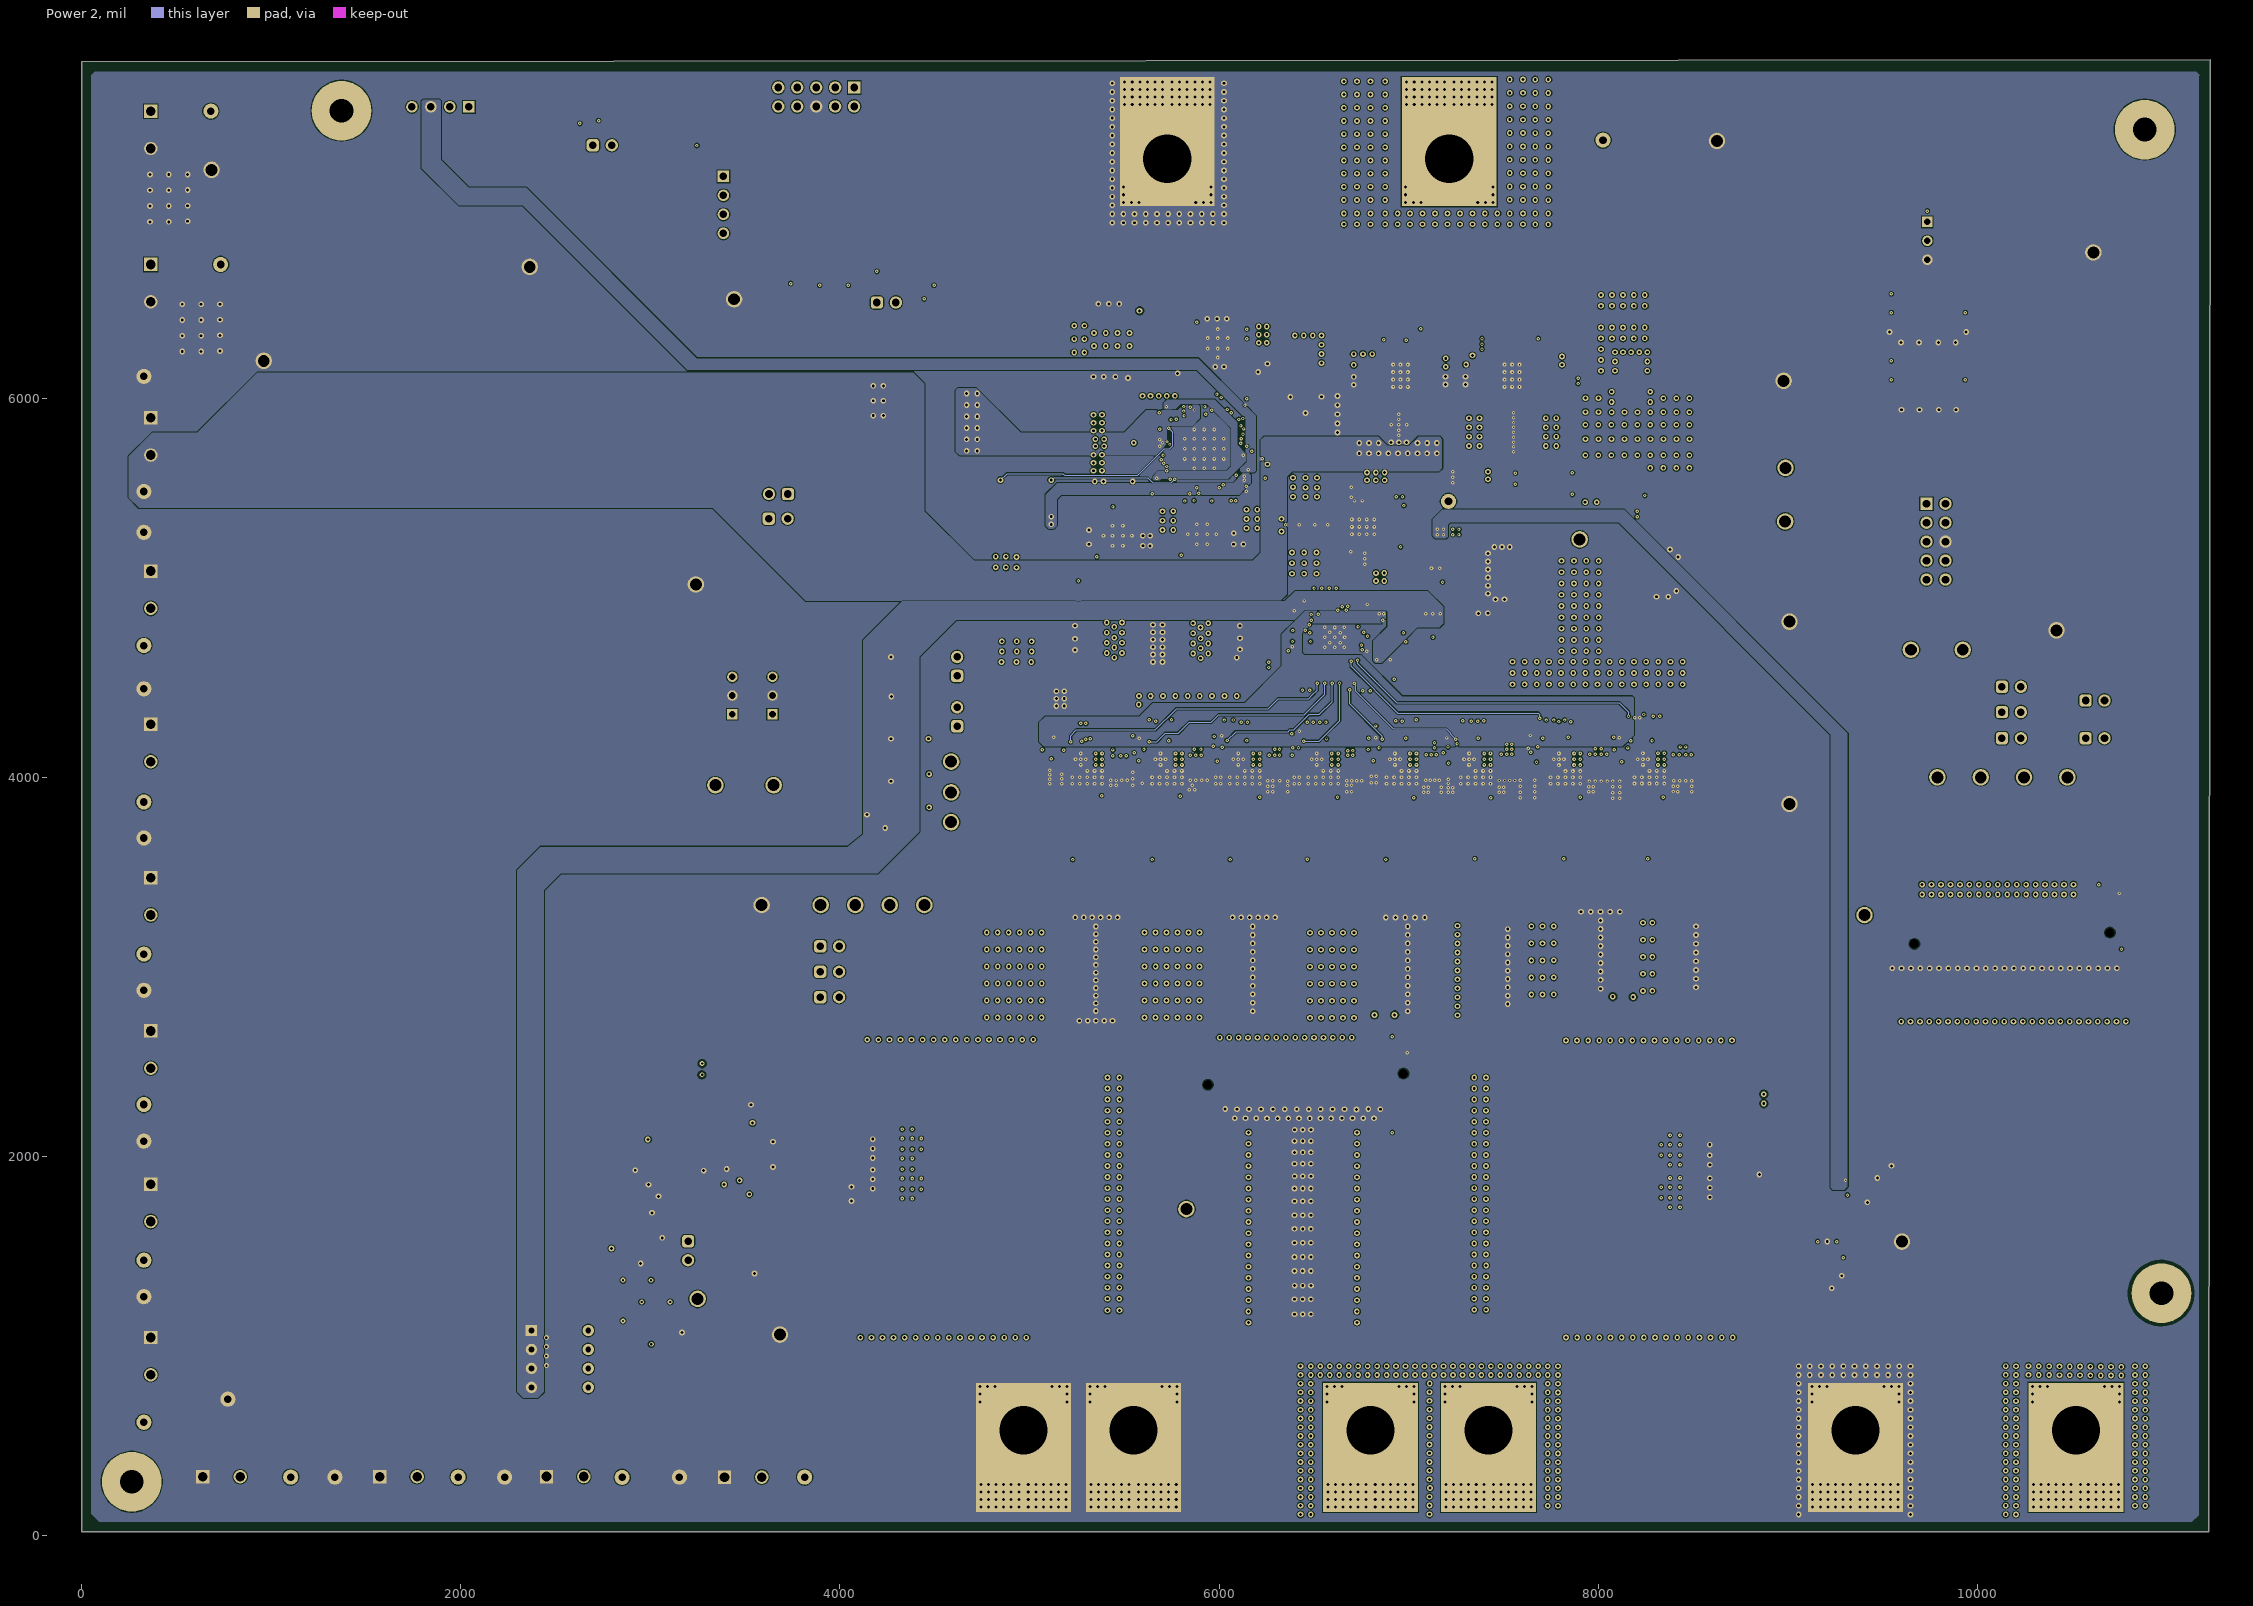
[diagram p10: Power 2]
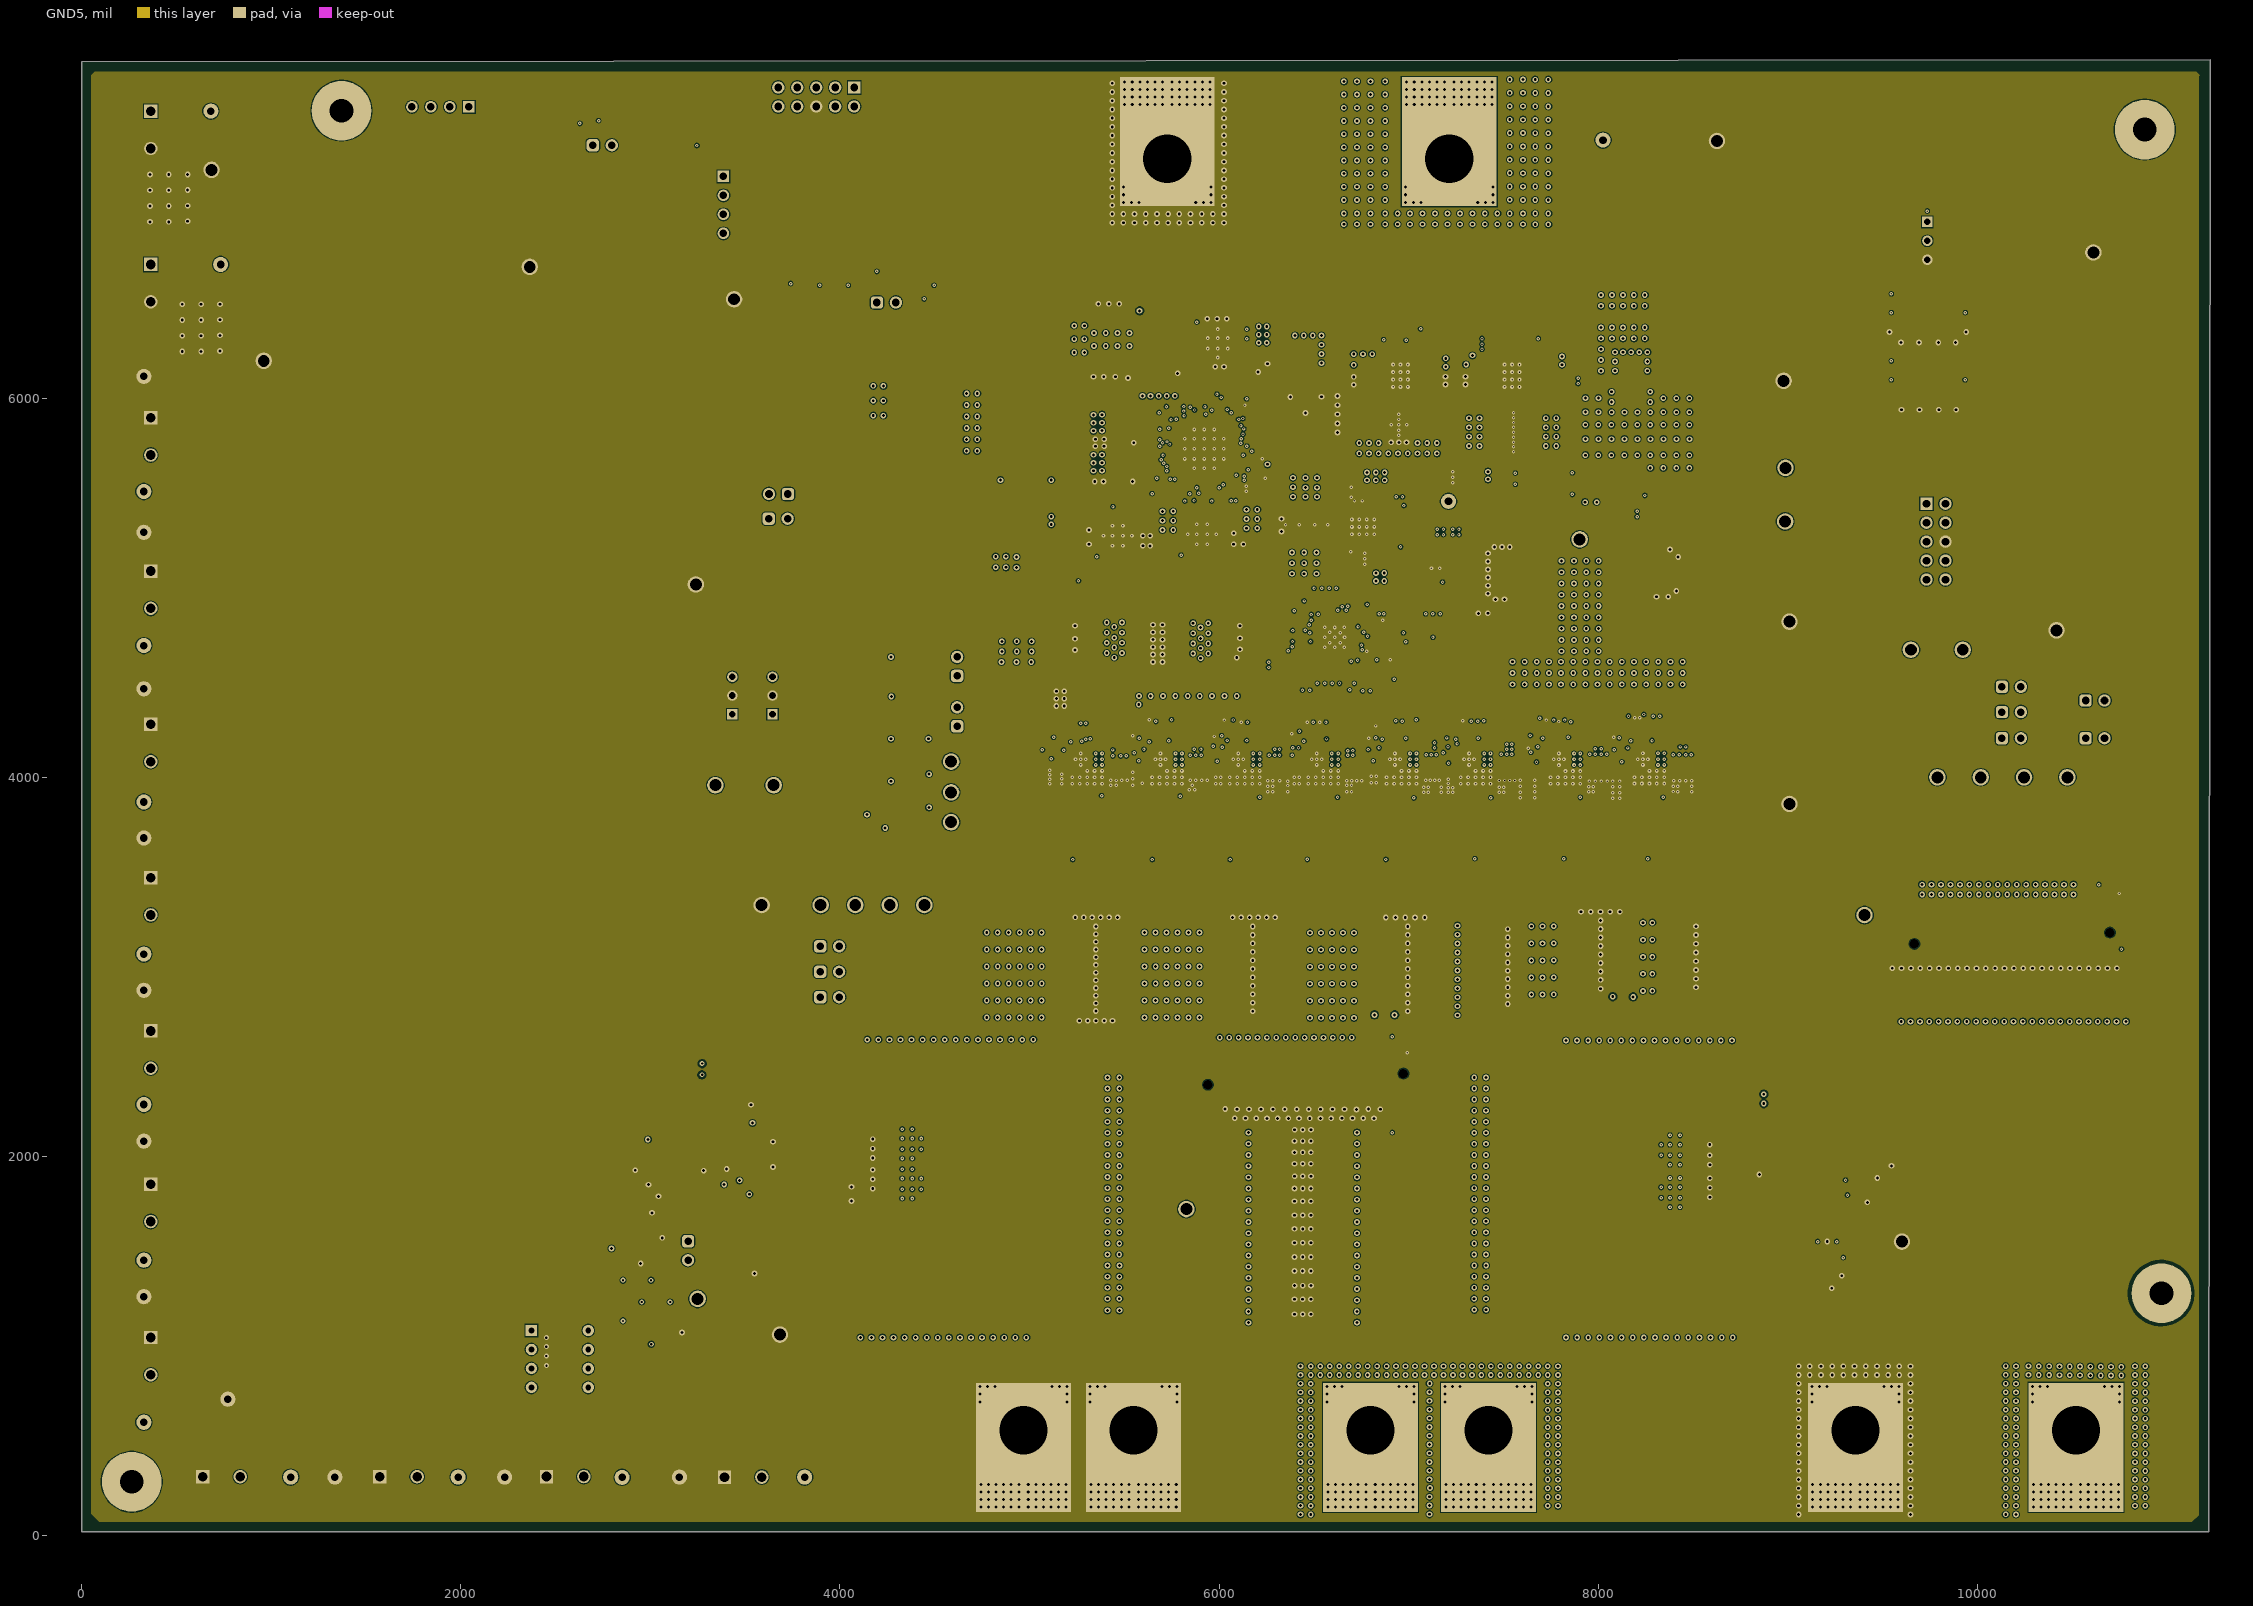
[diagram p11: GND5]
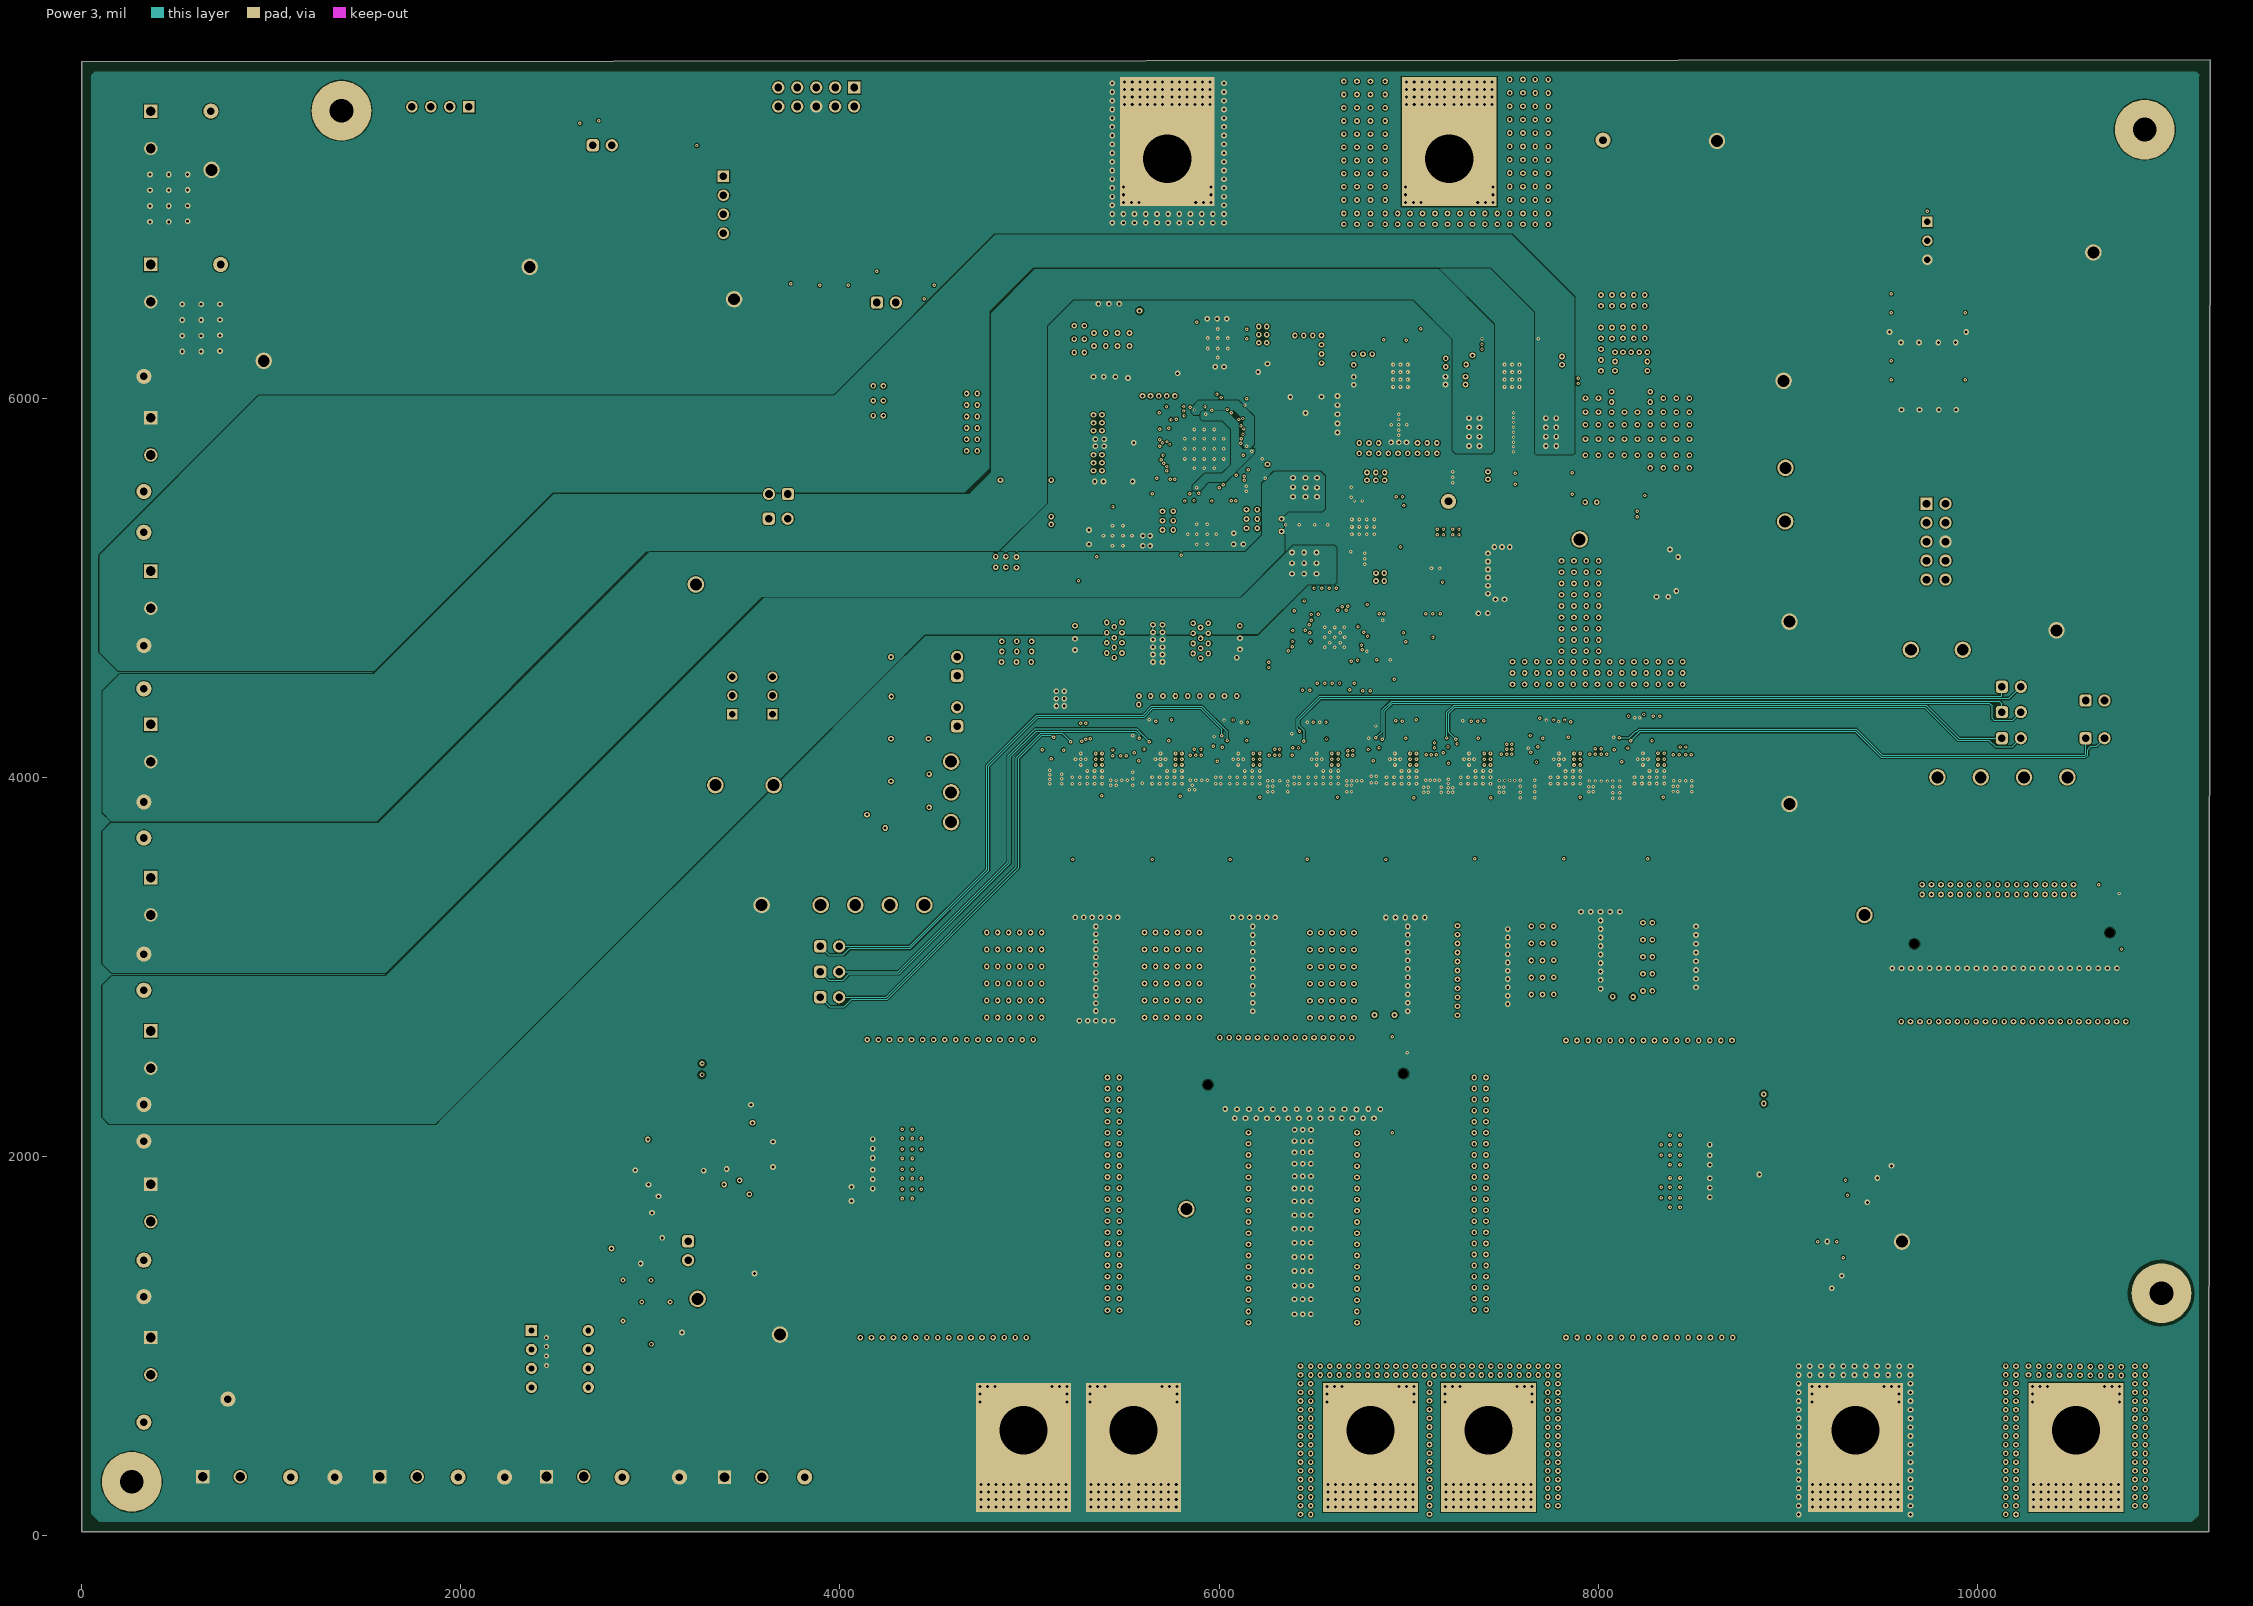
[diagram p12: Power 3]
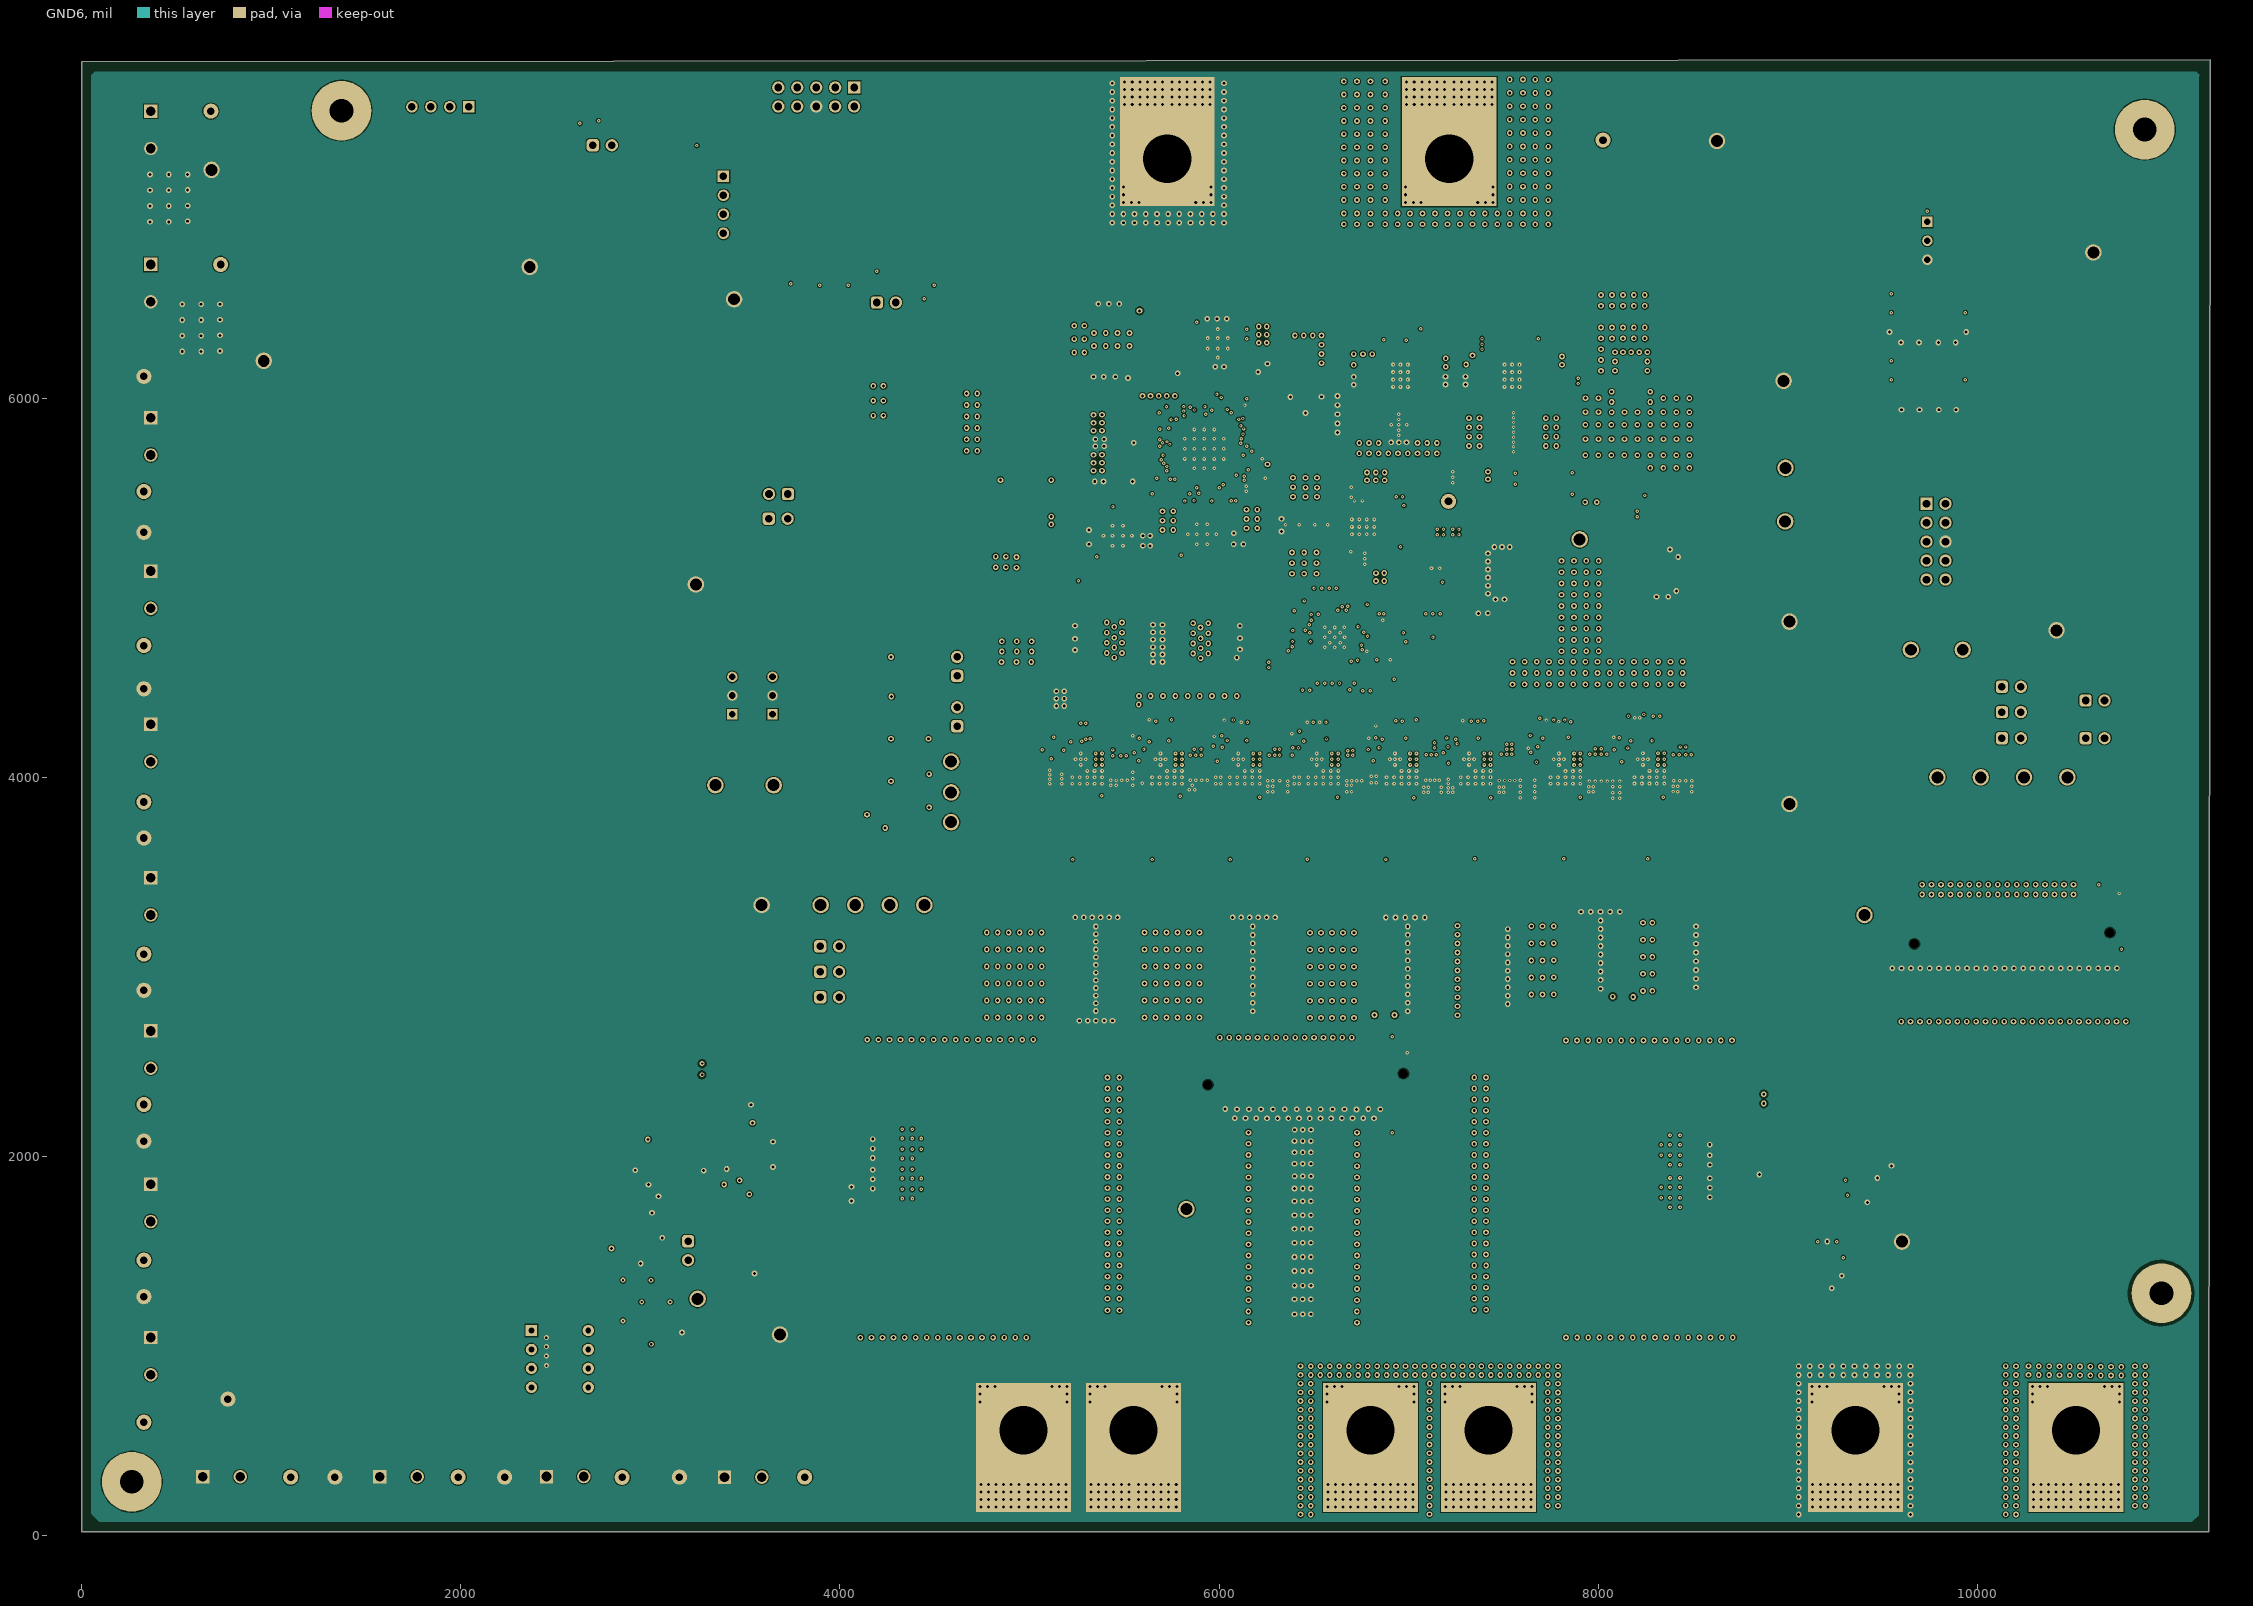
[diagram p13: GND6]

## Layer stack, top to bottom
Top Solder: solder mask 0.4, Solder Resist, Dk 3.5
Top Layer: signal copper 1.4
Dielectric 2: dielectric 10, Dk 4.2
GND1: signal copper 1.417
Dielectric 3: dielectric 10, Dk 4.2
Signal 1: signal copper 1.378
Dielectric 7: prepreg 2.8, PP-006, Dk 4.1
GND2: signal copper 1.378
Dielectric 9: prepreg 2.8, PP-006, Dk 4.1
Signal 2: signal copper 1.378
Dielectric 1: prepreg 2.8, PP-006, Dk 4.1
GND3: signal copper 1.417
Dielectric 11: prepreg 2.8, PP-006, Dk 4.1
Singal 3: signal copper 1.378
Dielectric1: core 10, FR-4 High Tg, Dk 4.8
Power 1: signal copper 1.378
Dielectric 12: prepreg 2.8, PP-006, Dk 4.1
GND4: signal copper 1.417
Dielectric 6: prepreg 2.8, PP-006, Dk 4.1
Power 2: signal copper 1.378
Dielectric 10: prepreg 2.8, PP-006, Dk 4.1
GND5: signal copper 1.378
Dielectric 8: prepreg 2.8, PP-006, Dk 4.1
Power 3: signal copper 1.378
Dielectric 4: dielectric 10, Dk 4.2
GND6: signal copper 1.417
Dielectric 5: dielectric 10, Dk 4.2
Bottom Layer: signal copper 1.4
Bottom Solder: solder mask 0.4, Solder Resist, Dk 3.5

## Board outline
0,21 0,7775.59 11229.24,7785.43 11220.55,21

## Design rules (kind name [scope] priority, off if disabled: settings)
AcuteAngle [All] p1: minimum=4.50000000000000E+0001 checktracksonly=FALSE
AssemblyTestPointUsage [All] p1: valid=2
BoardOutlineClearance BoardOutlineClearance_MountingHoles [OnCopper and InComponentClass('Mounting Holes')] p1: gap=39.37 ignorepadtopadclearanceinfootprint=FALSE
BoardOutlineClearance BoardOutlineClearance_Poly [OnCopper and IsPoly] p2: gap=50 ignorepadtopadclearanceinfootprint=FALSE
BoardOutlineClearance [OnCopper and Not InComponentClass('Logo') and not InComponentClass('FiducialMark') and not InRegion(1000,500,4000,800) and not InPoly] p3: gap=75 ignorepadtopadclearanceinfootprint=FALSE
Clearance Clearance_Keepouts [((IsTrack Or IsArc) And Not InPoly) And IsFree and IsKeepOut vs ((IsTrack Or IsArc) And Not InPoly) And IsFree and IsKeepOut] p1: gap=0 ignorepadtopadclearanceinfootprint=FALSE
Clearance Clearance_Poly [InPolygon] p2: gap=5 ignorepadtopadclearanceinfootprint=TRUE
Clearance Clearance_FiducialMark [IsKeepOut and InComponentClass('FiducialMark') vs IsPad and InComponentClass('FiducialMark')] p3: gap=0 ignorepadtopadclearanceinfootprint=FALSE
Clearance [All] p4: gap=5 ignorepadtopadclearanceinfootprint=TRUE
ComponentClearance ComponentClearance_MountingHoles_FiducialMarks [InComponentClass('Mounting Holes') vs InComponentClass('FiducialMark')] p1: gap=50 collisioncheckmode=3 verticalgap=10 showdistances=FALSE
ComponentClearance ComponentClearance_Shunt [InComponentClass('Header') vs InComponentClass('Shunt')] p2: gap=0 collisioncheckmode=3 verticalgap=0 showdistances=FALSE
ComponentClearance ComponentClearance_Logo [InComponentClass('Logo')] p3: gap=50 collisioncheckmode=3 verticalgap=10 showdistances=FALSE
ComponentClearance ComponentClearance_ScrewToNut [(HasFootprint('NY PMS 440 0025 PH')) vs (HasFootprint('Keystone_1902C'))] p4: gap=5 collisioncheckmode=3 verticalgap=10 showdistances=FALSE
ComponentClearance ComponentClearance_MountingHoles [InComponentClass('Mounting Holes')] p5: gap=250 collisioncheckmode=3 verticalgap=100000 showdistances=FALSE
ComponentClearance ComponentClearance_SmallPassives [HasFootprint('0201*') or HasFootprint('0402*') or HasFootprint('0508') or HasFootprint('0603*') or HasFootprint('0612') or HasFootprint('0805*') or HasFootprint('0815*') or HasFootprint('0830*') or HasFootprint('1206*') or HasFootprint('1210*') or HasFootprint('1808*') or HasFootprint('1812*') or HasFootprint('1825*') or HasFootprint('2010*') or HasFootprint('2220*') or HasFootprint('2225*') or HasFootprint('2512*') or HasFootprint('2728*') or HasFootprint('3518*') vs HasFootprint('0201*') or HasFootprint('0402*') or HasFootprint('0508') or HasFootprint('0603*') or HasFootprint('0612') or HasFootprint('0805*') or HasFootprint('0815*') or HasFootprint('0830*') or HasFootprint('1206*') or HasFootprint('1210*') or HasFootprint('1808*') or HasFootprint('1812*') or HasFootprint('1825*') or HasFootprint('2010*') or HasFootprint('2220*') or HasFootprint('2225*') or HasFootprint('2512*') or HasFootprint('2728*') or HasFootprint('3518*')] p6: gap=9 collisioncheckmode=3 verticalgap=10 showdistances=FALSE
ComponentClearance ComponentClearance_THtoSMT [IsThruComponent vs IsSMTComponent] p7: gap=40 collisioncheckmode=3 verticalgap=30 showdistances=FALSE
ComponentClearance ComponentClearance_THtoTH [IsThruComponent vs IsThruComponent] p8: gap=30 collisioncheckmode=3 verticalgap=30 showdistances=FALSE
ComponentClearance [All] p9: gap=9 collisioncheckmode=3 verticalgap=10 showdistances=FALSE
DiffPairsRouting [All] p1: maxlimit=100 minlimit=10 mostfreqgap=10 toplayer_minwidth=15 toplayer_maxwidth=15 toplayer_prefwidth=15 midlayer1_minwidth=15 midlayer1_maxwidth=15 midlayer1_prefwidth=15 midlayer2_minwidth=15 midlayer2_maxwidth=15 midlayer2_prefwidth=15 midlayer3_minwidth=15 midlayer3_maxwidth=15 midlayer3_prefwidth=15 midlayer4_minwidth=15 midlayer4_maxwidth=15 midlayer4_prefwidth=15 midlayer5_minwidth=15 midlayer5_maxwidth=15 midlayer5_prefwidth=15 midlayer6_minwidth=15 midlayer6_maxwidth=15 midlayer6_prefwidth=15 midlayer7_minwidth=15 midlayer7_maxwidth=15 midlayer7_prefwidth=15 midlayer8_minwidth=15 midlayer8_maxwidth=15 midlayer8_prefwidth=15 midlayer9_minwidth=15 midlayer9_maxwidth=15 midlayer9_prefwidth=15 midlayer10_minwidth=15 midlayer10_maxwidth=15 midlayer10_prefwidth=15 midlayer11_minwidth=15 midlayer11_maxwidth=15 midlayer11_prefwidth=15 midlayer12_minwidth=15 midlayer12_maxwidth=15 midlayer12_prefwidth=15 bottomlayer_minwidth=15 bottomlayer_maxwidth=15 bottomlayer_prefwidth=15 maxuncoupledlength=1000
FabricationTestPointUsage TestPointUsage [All] p1: valid=2 allowmultiple=FALSE
FabricationTestpoint Testpoint [All] p1: side=3 testpointundercomponent=TRUE minsize=40 maxsize=100 preferedsize=60 minholesize=0 maxholesize=40 preferedholesize=32 testpointgrid=1 allowsidetop=TRUE allowsidebottom=TRUE usegrid=TRUE gridtolerance=0.01
FanoutControl Fanout_LCC [IsLCC] p1: bgadir=Out bgaviamode=Centered fanoutstyle=Auto fanoutdirection=Alternating viagrid=1 // Fanout_LCC (Default Rule)
FanoutControl Fanout_BGA [IsBGA] p2: bgadir=Out bgaviamode=Centered fanoutstyle=Auto fanoutdirection=Alternating viagrid=1 // Fanout_BGA (Default Rule)
FanoutControl Fanout_Default [All] p4: bgadir=Out bgaviamode=Centered fanoutstyle=Auto fanoutdirection=Alternating viagrid=1 // Fanout_Default (Default Rule)
FanoutControl Fanout_Small [(CompPinCount < 5)] p5: bgadir=Out bgaviamode=Centered fanoutstyle=Auto fanoutdirection=OutThenIn viagrid=1 // Fanout_Small (Default Rule)
HoleSize [All] p1: absolutevalues=TRUE maxlimit=251 minlimit=7.87 maxpercent=80.000 minpercent=20.000
MinimumAnnularRing MinimumAnnularRing_ThermalPadVias [IsVia and InAnyComponent] p1: minimumring=5.91
MinimumAnnularRing [All] p2: minimumring=4
MinimumSolderMaskSliver MinimumSolderMaskSliver_Logo [InComponentClass('Logo') vs InComponentClass('Logo')] p1: minsoldermaskwidth=0.7
MinimumSolderMaskSliver [All] p2: minsoldermaskwidth=1.5
PlaneClearance [All] p1: clearance=3
PlaneConnect [All] p1: planeconnectstyle=Direct reliefexpansion=10 reliefentries=4 reliefconductorwidth=10 reliefairgap=10
PolygonConnect [All] p1: connectstyle=Direct reliefconductorwidth=10 reliefentries=4 polygonreliefangle="90 Angle" airgapwidth=10
PolygonConnect PolygonConnect_1 [InComponentClass('TPSM5D1806 IND')] p2: connectstyle=Direct reliefconductorwidth=10 reliefentries=4 polygonreliefangle="90 Angle" airgapwidth=10
RoomDefinition TPS6508641_Project_Buck6 [InComponentClass('TPS6508641_Project_Buck6')] p1: confinementstyle=ConfineIn formatcopy=TRUE lockcomponents=FALSE outline -692,-1534 1308,-1534 1308,-534 -692,-534
RoomDefinition "TPSM5D1806 Multi Phase" [InComponentClass('TPSM5D1806 Multi Phase')] p2: confinementstyle=ConfineIn formatcopy=TRUE lockcomponents=FALSE outline -692,-1534 1308,-1534 1308,-534 -692,-534
RoomDefinition "TPSM5D1806 IND" [InComponentClass('TPSM5D1806 IND')] p3: confinementstyle=ConfineIn formatcopy=TRUE lockcomponents=FALSE outline -692,-1534 1308,-1534 1308,-534 -692,-534
RoomDefinition TPS6508641_Support_Devices [InComponentClass('TPS6508641_Support_Devices')] p4: confinementstyle=ConfineIn formatcopy=TRUE lockcomponents=FALSE outline -692,-1534 1308,-1534 1308,-534 -692,-534
RoomDefinition TPS6508641_Project_TPS65086 [InComponentClass('TPS6508641_Project_TPS65086')] p5: confinementstyle=ConfineIn formatcopy=TRUE lockcomponents=FALSE outline -692,-1534 1308,-1534 1308,-534 -692,-534
RoomDefinition TPS6508641_Project_Buck345 [InComponentClass('TPS6508641_Project_Buck345')] p6: confinementstyle=ConfineIn formatcopy=TRUE lockcomponents=FALSE outline -692,-1534 1308,-1534 1308,-534 -692,-534
RoomDefinition TPS6508641_Project_Buck12 [InComponentClass('TPS6508641_Project_Buck12')] p7: confinementstyle=ConfineIn formatcopy=TRUE lockcomponents=FALSE outline -692,-1534 1308,-1534 1308,-534 -692,-534
RoomDefinition Hardware [InComponentClass('Hardware')] p8: confinementstyle=ConfineIn formatcopy=TRUE lockcomponents=FALSE outline -692,-1534 1308,-1534 1308,-534 -692,-534
RoomDefinition "EVRHC008_VOUT_B_Phases 1-2" [InComponentClass('EVRHC008_VOUT_B_Phases 1-2')] p9: confinementstyle=ConfineIn formatcopy=TRUE lockcomponents=FALSE outline -692,-1534 1308,-1534 1308,-534 -692,-534
RoomDefinition "EVRHC008_VOUT_A_Phases 4-5-6" [InComponentClass('EVRHC008_VOUT_A_Phases 4-5-6')] p10: confinementstyle=ConfineIn formatcopy=TRUE lockcomponents=FALSE outline -692,-1534 1308,-1534 1308,-534 -692,-534
RoomDefinition "EVRHC008_VOUT_A_Phases 1-2-3" [InComponentClass('EVRHC008_VOUT_A_Phases 1-2-3')] p11: confinementstyle=ConfineIn formatcopy=TRUE lockcomponents=FALSE outline -692,-1534 1308,-1534 1308,-534 -692,-534
RoomDefinition "EVRHC008_HelperCkts and Indicators" [InComponentClass('EVRHC008_HelperCkts and Indicators')] p12: confinementstyle=ConfineIn formatcopy=TRUE lockcomponents=FALSE outline -692,-1534 1308,-1534 1308,-534 -692,-534
RoomDefinition "EVRHC008_  Filters" [InComponentClass('EVRHC008_  Filters')] p13: confinementstyle=ConfineIn formatcopy=TRUE lockcomponents=FALSE outline -692,-1534 1308,-1534 1308,-534 -692,-534
RoomDefinition "EVRHC008_ Dynamic Load" [InComponentClass('EVRHC008_ Dynamic Load')] p14: confinementstyle=ConfineIn formatcopy=TRUE lockcomponents=FALSE outline -692,-1534 1308,-1534 1308,-534 -692,-534
RoomDefinition "EVRHC008_ CONTROLLER_6X6" [InComponentClass('EVRHC008_ CONTROLLER_6X6')] p15: confinementstyle=ConfineIn formatcopy=TRUE lockcomponents=FALSE outline -692,-1534 1308,-1534 1308,-534 -692,-534
RoomDefinition "EVRHC008_Aux Power" [InComponentClass('EVRHC008_Aux Power')] p16: confinementstyle=ConfineIn formatcopy=TRUE lockcomponents=FALSE outline -692,-1534 1308,-1534 1308,-534 -692,-534
RoutingVias ThermalPadVias [IsVia and InAnyComponent] p1: holewidth=7.87 width=19.68 viastyle="Through Hole" minholewidth=7.87 minwidth=19.68 maxholewidth=12.99 maxwidth=23.62
RoutingVias [All] p2: holewidth=8 width=18 viastyle="Through Hole" minholewidth=5 minwidth=10 maxholewidth=40 maxwidth=64
SMDEntry [All] p1 off: side=TRUE corner=TRUE anyangle=FALSE
SMDToCorner [All] p1 off: distance=50000
SilkToBoardRegionClearance [Not ((IsComment or IsDesignator) And (Hide <> 'False')) and not InRegion(1000,500,4000,800)] p1:
SilkToSilkClearance SilkToSilkClearance_Pb-FreeLogo [(HasFootprint('Pb-Free_Overlay_Medium') OR HasFootprint('Pb-Free_Overlay_Small')) vs (HasFootprint('Pb-Free_Overlay_Medium') OR HasFootprint('Pb-Free_Overlay_Small'))] p1: silktosilkclearance=0
SilkToSilkClearance [All] p2: silktosilkclearance=0
SilkToSolderMaskClearance SilkToComponentPadClearance [(IsPad or IsFill or IsRegion) and InAnycomponent] p1: minsilkscreentomaskgap=5 clearancetoexposedcopper=TRUE
SilkToSolderMaskClearance "Silk to Solder Mask Opening" [All] p2: minsilkscreentomaskgap=3.94 clearancetoexposedcopper=FALSE
SolderMaskExpansion [All] p1: expansion=4 istentingtop=FALSE
UnRoutedNet [All] p1: checkbadconnections=TRUE
Width [All] p1: maxlimit=100 minlimit=5 preferedwidth=6 checkconnectedcopper=TRUE
13 further rules are at their usual default settings.

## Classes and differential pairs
component class TPS6508641_Project_Buck6: C299 C300 C301 C302 C303 C304 C305 C306 C399 C400 C401 J13 L10 NT8 NT19 Q10 R211 TP47 TP48
component class Hardware: H1 H2 H3 H4 H5 H6 H7 H8 Logo1 Logo2 Logo3 Logo4
component class "TPSM5D1806 IND": C370 C371 C372 C373 C374 C375 C376 C377 C378 C379 C380 C381 C382 C383 C384 C385 C386 C387 C388 C389 C390 C391 C392 C393 C394 C395 J25 J27 J34 J35 J36 J37 NT17 NT18 R233 R234 R235 R236 R237 R238 R239 R240 R241 R242 R243 R244 R245 R246 TP67 TP68 TP69 TP77 TP80 TP81 TP82 TP83 U18 U19
component class "TPSM5D1806 Multi Phase": C357 C358 C359 C360 C361 C362 C363 C364 C365 C366 C367 C368 C369 J28 J33 NT7 NT16 R228 R229 R230 R231 R232 TP1 TP5 U17
component class TPS6508641_Support_Devices: C353 C354 C355 C356 J1 J4 J26 J29 J30 J31 R221 R222 R223 R224 R225 R226 R227 TP70 TP71 TP72 TP73 TP74 TP75 TP76 TP78 TP79
component class TPS6508641_Project_TPS65086: C336 C337 C338 C339 C340 C341 C342 C343 C344 C345 C346 C347 C348 C349 C350 C351 C352 C397 J19 J20 J21 J22 J23 J24 R214 R215 R216 R217 R218 R219 R220 S4 TP59 TP60 TP61 TP62 TP63 TP64 TP65 TP66 U16
component class TPS6508641_Project_Buck345: C326 C327 C328 C329 C330 C331 C332 C333 C334 C335 C396 J16 J17 J18 L13 L14 L15 NT13 NT14 NT15 TP53 TP54 TP55 TP56 TP57 TP58
component class TPS6508641_Project_Buck12: C307 C308 C309 C310 C311 C312 C313 C314 C315 C316 C317 C318 C319 C320 C321 C322 C323 C324 C325 C398 J14 J15 L11 L12 NT9 NT10 NT11 NT12 Q11 Q12 R212 R213 TP49 TP50 TP51 TP52
component class "EVRHC008_VOUT_B_Phases 1-2": C267 C268 C269 C270 C271 C272 C273 C274 C275 C276 C277 C278 C279 C280 C281 C282 C283 C284 C285 C286 C287 C288 C289 C290 C291 C292 C293 C294 C295 C296 C297 C298 J43 J44 L8 L9 R195 R196 R197 R198 R199 R200 R201 R202 R203 R204 R205 R206 R207 R208 R209 R210 TP43 TP45 U14 U15
component class "EVRHC008_VOUT_A_Phases 4-5-6": C219 C220 C221 C222 C223 C224 C225 C226 C227 C228 C229 C230 C231 C232 C233 C234 C235 C236 C237 C238 C239 C240 C241 C242 C243 C244 C245 C246 C247 C248 C249 C250 C251 C252 C253 C254 C255 C256 C257 C258 C259 C260 C261 C262 C263 C264 C265 C266 J40 J41 J42 L5 L6 L7 R171 R172 R173 R174 R175 R176 R177 R178 R179 R180 R181 R182 R183 R184 R185 R186 R187 R188 R189 R190 R191 R192 R193 R194 TP37 TP39 TP41 U11 U12 U13
component class "EVRHC008_VOUT_A_Phases 1-2-3": C171 C172 C173 C174 C175 C176 C177 C178 C179 C180 C181 C182 C183 C184 C185 C186 C187 C188 C189 C190 C191 C192 C193 C194 C195 C196 C197 C198 C199 C200 C201 C202 C203 C204 C205 C206 C207 C208 C209 C210 C211 C212 C213 C214 C215 C216 C217 C218 J32 J38 J39 L2 L3 L4 R147 R148 R149 R150 R151 R152 R153 R154 R155 R156 R157 R158 R159 R160 R161 R162 R163 R164 R165 R166 R167 R168 R169 R170 TP31 TP33 TP35 U8 U9 U10
component class "EVRHC008_HelperCkts and Indicators": D14 D15 D16 D17 D18 J11 J12 NT3 NT4 NT5 NT6 Q5 Q6 Q7 Q8 Q9 R130 R131 R132 R133 R134 R135 R136 R137 R138 R139 R140 R141 R142 R143 R144 R145 R146 TP21 TP22 TP23 TP24 TP25 TP26 TP27 TP28 TP29 TP30 TP84 TP85 TP86 TP87
component class "EVRHC008_  Filters": C82 C83 C84 C85 C86 C87 C88 C89 C90 C91 C92 C93 C94 C95 C96 C97 C98 C99 C100 C101 C102 C103 C104 C105 C106 C107 C108 C109 C110 C111 C112 C113 C114 C115 C116 C117 C118 C119 C120 C121 C122 C123 C124 C125 C126 C127 C128 C129 C130 C131 C132 C133 C134 C135 C136 C137 C138 C139 C140 C141 C142 C143 C144 C145 C146 C147 C148 C149 C150 C151 C152 C153 C154 C155 C156 C157 C158 C159 C160 C161 C162 C163 C164 C165 C166 C167 C168 C169 C170 J9 J10 L1 NT1 NT2 R128 R129 T1 T2 T3 T4 T5 T6 T7 T8 TP14 TP15 TP16 TP17 TP18 TP19 TP20
component class "EVRHC008_ Dynamic Load": C26 C27 C28 C29 C30 C31 C32 C33 C34 C35 C36 C37 C38 C39 C40 C41 C42 C43 C44 C45 C46 C47 C48 C49 C50 C51 C52 C53 C54 C55 C56 C57 C58 C59 C60 C61 C62 C63 C64 C65 C66 C67 C68 C69 C70 C71 C72 C73 C74 C75 C76 C77 C78 C79 C80 C81 D1 D2 D3 D4 D5 D6 D7 D8 D9 D10 D11 D12 D13 J8 Q1 Q2 Q3 Q4 R39 R40 R41 R42 R43 R44 R45 R46 R47 R48 R49 R50 R51 R52 R53 R54 R55 R56 R57 R58 R59 R60 R61 R62 R63 R64 R65 R66 R67 R68 R69 R70 R71 R72 R73 R74 R75 R76 R77 R78 R79 R80 R81 R82 R83 R84 R85 R86 R87 R88 R89 R90 R91 R92 R93 R94 R95 R96 R97 R98 R99 R100 R101 R102 R103 R104 R105 R106 R107 R108 R109 R110 R111 R112 R113 R114 R115 R116 R117 R118 R119 R120 R121 R122 R123 R124 R125 R126 R127 S3 TP13 U4 U5 U6 U7
component class "EVRHC008_ CONTROLLER_6X6": C9 C10 C11 C12 C13 C14 C15 C16 C17 C18 C19 C20 C21 C22 C23 C24 C25 J2 J3 J5 J6 J7 R7 R8 R9 R10 R11 R12 R13 R14 R15 R16 R17 R18 R19 R20 R21 R22 R23 R24 R25 R26 R27 R28 R29 R30 R31 R32 R33 R34 R35 R36 R37 R38 S1 S2 TP8 TP9 TP10 TP11 TP12 U3
component class "EVRHC008_Aux Power": C1 C2 C3 C4 C5 C6 C7 C8 R1 R2 R3 R4 R5 R6 TP2 TP3 TP4 TP6 TP7 U1 U2

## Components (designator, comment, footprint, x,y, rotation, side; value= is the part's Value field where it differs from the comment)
C1 "TMK107BBJ106MA-T" 0603S 7131.39,4997.2 r180 bottom value=10uF
C2 "06035C104KAT2A" 0603S 7129.1,5239.78 r180 bottom value=0.1uF
C3 "TMK107BBJ106MA-T" 0603S 7129.46,5189.29 r180 bottom value=10uF
C4 "C1608X5R1E106M080AC" 0603S 7379.42,5629.22 r90 bottom value=10uF
C5 "GRM21BR61E226ME44L" 0805_HV 7074.78,5455.65 r180 bottom value=22uF
C6 "GRM21BR61E226ME44L" 0805_HV 7351.4,5455.65 r0 bottom value=22uF
C7 "GCM188R71C105KA64D" 0603S 7095.36,4923.84 r90 bottom value=1uF
C8 "CGA2B2X7R1H332K050BA" 0402 7233.97,5691 r0 bottom value=3300pF
C9 "C0603C475K8PACTU" 0603S 6793.12,4812.9 r0 bottom value=4.7uF
C10 "C0402C101J3GACTU" 0402S 6459.35,4488.8 r0 top value=100pF
C11 "GRM1555C1H220JA01D" 0402S 6964.5,2567.3 r270 bottom value=22pF
C12 "C0402C101J3GACTU" 0402S 6776.79,4489.62 r180 top value=100pF
C13 "GRM1555C1H220JA01D" 0402S 10701.64,3387.33 r0 top value=22pF
C14 "GRM1555C1H220JA01D" 0402S 6893.84,2151.33 r180 top value=22pF
C15 "GRM1555C1H220JA01D" 0402S 10883.47,3016.33 r270 top value=22pF
C16 "GCM188R71C105KA64D" 0603S 6786.79,4828.6 r0 top value=1uF
C17 "C0402C102K5RACTU" 0402S 4505.5,4405.6 r270 top value=1000pF
C18 "C0402C102K5RACTU" 0402S 4505.5,4616.69 r270 top value=1000pF
C19 "GCM188R71C105KA64D" 0603S 7662.2,5635.6 r90 bottom value=1uF
C20 "GCM188R71C105KA64D" 0603S 7603.5,5576 r270 bottom value=1uF
C21 "GRM155R71E222KA01D" 0402S 6868.12,4783.14 r90 top value=2200pF
C22 "GRM155R71E222KA01D" 0402S 6868.12,4694.2 r270 top value=2200pF
C23 "GRM033Z71C104KE14D" 0201 6439.29,4859.97 r0 top value=0.1uF
C24 "GRM033Z71C104KE14D" 0201 6480,4937.61 r270 bottom value=0.1uF
C25 "GCM188R71C105KA64D" 0603S 7662.2,5515.3 r270 bottom value=1uF
C26 "08053C104KAT2A" 0805M 2990.23,1964.85 r270 top value=0.1uF
C27 "GCM188R71C105KA64D" 0603 3523.54,1905.71 r270 top value=1uF
C28 "08051C103JAT2A" 0805_HV 3344.56,1964.85 r270 top value=0.01uF
C29 "08051C103JAT2A" 0805_HV 3106.64,1699.1 r180 top value=0.01uF
C30 "GCM188R71C105KA64D" 0603 9365.8,1788.7 r90 top value=1uF
C31 "08053C104KAT2A" 0805M 2834.71,1436.6 r180 top value=0.1uF
C32 "GRM31CR60G227ME11L" 1206_190 6278.75,1167.48 r0 top value=220uF
C33 "GRM31CR60G227ME11L" 1206_190 6603.73,1152.76 r180 top value=220uF
C34 "GRM31CR60G227ME11L" 1206_190 6277.5,2112.36 r0 top value=220uF
C35 "GRM31CR60G227ME11L" 1206_190 6277.5,2018.31 r0 top value=220uF
C36 "GRM31CR60G227ME11L" 1206_190 6277.5,1924.26 r0 top value=220uF
C37 "GRM31CR60G227ME11L" 1206_190 6277.5,1830.21 r0 top value=220uF
C38 "GRM31CR60G227ME11L" 1206_190 6277.5,1736.15 r0 top value=220uF
C39 "GRM31CR60G227ME11L" 1206_190 6277.5,1642.1 r0 top value=220uF
C40 "GRM31CR60G227ME11L" 1206_190 6277.5,1548.05 r0 top value=220uF
C41 "GRM31CR60G227ME11L" 1206_190 6277.5,1454 r0 top value=220uF
C42 "GRM31CR60G227ME11L" 1206_190 6277.5,1359.95 r0 top value=220uF
C43 "GRM31CR60G227ME11L" 1206_190 6277.5,1265.9 r0 top value=220uF
C44 "GRM31CR60G227ME11L" 1206_190 6606.6,2097.71 r180 top value=220uF
C45 "GRM31CR60G227ME11L" 1206_190 6606.6,2003.65 r180 top value=220uF
C46 "GRM31CR60G227ME11L" 1206_190 6606.6,1909.59 r180 top value=220uF
C47 "GRM31CR60G227ME11L" 1206_190 6606.6,1815.53 r180 top value=220uF
C48 "GRM31CR60G227ME11L" 1206_190 6606.6,1721.48 r180 top value=220uF
C49 "GRM31CR60G227ME11L" 1206_190 6606.6,1627.42 r180 top value=220uF
C50 "GRM31CR60G227ME11L" 1206_190 6606.6,1533.36 r180 top value=220uF
C51 "GRM31CR60G227ME11L" 1206_190 6606.6,1439.3 r180 top value=220uF
C52 "GRM31CR60G227ME11L" 1206_190 6606.6,1345.24 r180 top value=220uF
C53 "GRM31CR60G227ME11L" 1206_190 6606.6,1251.18 r180 top value=220uF
C54 "GRM31CR60G227ME11L" 1206_190 6277.5,2112.36 r0 bottom value=220uF
C55 "GRM31CR60G227ME11L" 1206_190 6277.5,2018.31 r0 bottom value=220uF
C56 "GRM31CR60G227ME11L" 1206_190 6277.5,1924.26 r0 bottom value=220uF
C57 "GRM31CR60G227ME11L" 1206_190 6277.5,1830.21 r0 bottom value=220uF
C58 "GRM31CR60G227ME11L" 1206_190 6277.5,1736.16 r0 bottom value=220uF
C59 "GRM31CR60G227ME11L" 1206_190 6277.5,1642.1 r0 bottom value=220uF
C60 "GRM31CR60G227ME11L" 1206_190 6277.5,1548.05 r0 bottom value=220uF
C61 "GRM31CR60G227ME11L" 1206_190 6277.5,1454 r0 bottom value=220uF
C62 "GRM31CR60G227ME11L" 1206_190 6606.6,2003.65 r180 bottom value=220uF
C63 "GRM31CR60G227ME11L" 1206_190 6606.6,2097.71 r180 bottom value=220uF
C64 "GRM31CR60G227ME11L" 1206_190L 5234.95,3079.95 r0 bottom value=220uF
C65 "GRM31CR60G227ME11L" 1206_190L 5234.95,2983.1 r0 bottom value=220uF
C66 "GRM31CR60G227ME11L" 1206_190L 5464.93,2882.29 r180 bottom value=220uF
C67 "GRM31CR60G227ME11L" 1206_190L 5464.93,2980.98 r180 bottom value=220uF
C68 "GRM31CR60G227ME11L" 1206_190L 6310.27,3086.24 r180 bottom value=220uF
C69 "GRM31CR60G227ME11L" 1206_190L 6310.27,2895.59 r180 bottom value=220uF
C70 "GRM31CR60G227ME11L" 1206_190L 6872.74,2898.74 r0 bottom value=220uF
C71 "GRM31CR60G227ME11L" 1206_190L 7120.5,2898.85 r180 bottom value=220uF
C72 "GRM31CR60G227ME11L" 1206_190 6277.5,1359.95 r0 bottom value=220uF
C73 "GRM31CR60G227ME11L" 1206_190 6277.5,1265.9 r0 bottom value=220uF
C74 "GRM31CR60G227ME11L" 1206_190 6606.6,1251.18 r180 bottom value=220uF
C75 "GRM31CR60G227ME11L" 1206_190 6606.6,1345.24 r180 bottom value=220uF
C76 "GRM31CR60G227ME11L" 1206_190 6606.6,1439.3 r180 bottom value=220uF
C77 "GRM31CR60G227ME11L" 1206_190 6606.6,1533.36 r180 bottom value=220uF
C78 "GRM31CR60G227ME11L" 1206_190 6606.6,1627.42 r180 bottom value=220uF
C79 "GRM31CR60G227ME11L" 1206_190 6606.6,1721.48 r180 bottom value=220uF
C80 "GRM31CR60G227ME11L" 1206_190 6606.6,1815.53 r180 bottom value=220uF
C81 "GRM31CR60G227ME11L" 1206_190 6606.6,1909.6 r180 bottom value=220uF
C82 "0603YC823KAT2A" 0603S 8254.9,5363.5 r270 top value=0.082uF
C83 "TCN4227M025R0100" FP-TCN4227M025R0100_2924-MFG 7384.67,4680.55 r90 top value=220µF
C84 "TCN4227M025R0100" FP-TCN4227M025R0100_2924-MFG 7591.88,5080.16 r180 top value=220µF
C85 "TCN4227M025R0100" FP-TCN4227M025R0100_2924-MFG 8228,5080.16 r0 top value=220µF
C86 "TCN4227M025R0100" FP-TCN4227M025R0100_2924-MFG 5364.66,4430.78 r180 top value=220µF
C87 "C3216X5R1V226M160AC" 1206_180L 8366.78,6291.39 r0 top value=22uF
C88 "C3216X5R1V226M160AC" 1206_180L 8366.78,6395.39 r0 top value=22uF
C89 "GRM31CR60G227ME11L" 1206_190L 6310.27,2989.83 r180 bottom value=220uF
C90 "GRM31CR60G227ME11L" 1206_190L 6872.74,3183.2 r0 bottom value=220uF
C91 "GRM31CR60G227ME11L" 1206_190L 7120.5,3088.72 r180 bottom value=220uF
C92 "GRM31CR60G227ME11L" 1206_190L 7120.5,3183.65 r180 bottom value=220uF
C93 "GRM31CR60G227ME11L" 1206_190L 6872.74,2993.56 r0 bottom value=220uF
C94 "GRM31CR60G227ME11L" 1206_190L 7120.5,2993.78 r180 bottom value=220uF
C95 "GRM31CR60G227ME11L" 1206_190L 7120.5,2803.92 r180 bottom value=220uF
C96 "GRM31CR60G227ME11L" 1206_190L 7401.4,2899.92 r0 bottom value=220uF
C97 "GRM31CR60G227ME11L" 1206_190L 7401.4,3187.92 r0 bottom value=220uF
C98 "GRM31CR60G227ME11L" 1206_190L 5464.93,3178.38 r180 bottom value=220uF
C99 "GRM31CR60G227ME11L" 1206_190L 5464.93,3079.68 r180 bottom value=220uF
C100 "GRM31CR60G227ME11L" 1206_190L 5234.95,3176.81 r0 bottom value=220uF
C101 "GRM31CR60G227ME11L" 1206_190L 5234.95,2886.26 r0 bottom value=220uF
C102 "GRM31CR60G227ME11L" 1206_190L 6046.81,2991.31 r0 bottom value=220uF
C103 "GRM31CR60G227ME11L" 1206_190L 6046.81,3087.72 r0 bottom value=220uF
C104 "GRM31CR60G227ME11L" 1206_190L 6046.81,2894.9 r0 bottom value=220uF
C105 "GRM31CR60G227ME11L" 1206_190L 6046.81,3184.12 r0 bottom value=220uF
C106 "GRM31CR60G227ME11L" 1206_190L 6872.74,3088.38 r0 bottom value=220uF
C107 "GRM31CR60G227ME11L" 1206_190L 6310.27,3181.19 r180 bottom value=220uF
C108 "GRM31CR60G227ME11L" 1206_190L 7401.4,3091.92 r0 bottom value=220uF
C109 "GRM31CR60G227ME11L" 1206_190L 5234.95,2779.17 r0 bottom value=220uF
C110 "GRM31CR60G227ME11L" 1206_190L 5464.93,2783.59 r180 bottom value=220uF
C111 "GRM31CR60G227ME11L" 1206_190L 7401.4,2803.92 r0 bottom value=220uF
C112 "GRM31CR60G227ME11L" 1206_190L 6872.74,2803.92 r0 bottom value=220uF
C113 "GRM31CR60G227ME11L" 1206_190L 5234.95,3079.95 r0 top value=220uF
C114 "GRM31CR60G227ME11L" 1206_190L 5234.95,2983.1 r0 top value=220uF
C115 "GRM31CR60G227ME11L" 1206_190L 5464.93,2878.58 r180 top value=220uF
C116 "GRM31CR60G227ME11L" 1206_190L 5464.93,2977.99 r180 top value=220uF
C117 "GRM31CR60G227ME11L" 1206_190L 6310.27,3078.58 r180 top value=220uF
C118 "GRM31CR60G227ME11L" 1206_190L 6310.27,2878.97 r180 top value=220uF
C119 "GRM31CR60G227ME11L" 1206_190L 6872.74,2898.74 r0 top value=220uF
C120 "GRM31CR60G227ME11L" 1206_190L 7120.5,2880.29 r180 top value=220uF
C121 "GRM31CR60G227ME11L" 1206_190L 7401.4,2995.92 r0 top value=220uF
C122 "GRM31CR60G227ME11L" 1206_190L 7401.4,2995.92 r0 bottom value=220uF
C123 "GRM31CR60G227ME11L" 1206_190L 6310.27,2779.17 r180 top value=220uF
C124 "GRM31CR60G227ME11L" 1206_190L 6046.81,2779.17 r0 top value=220uF
C125 "GRM31CR60G227ME11L" 1206_190L 6310.27,2797.66 r180 bottom value=220uF
C126 "GRM31CR60G227ME11L" 1206_190L 6045.97,2797.66 r0 bottom value=220uF
C127 "GRM31CR60G227ME11L" 1206_190L 8388.34,3005.62 r0 top value=220uF
C128 "GRM31CR60G227ME11L" 1206_190L 8388.34,2907.17 r0 top value=220uF
C129 "GRM31CR60G227ME11L" 1206_190L 10620.41,2886.15 r90 top value=220uF
C130 "GRM31CR60G227ME11L" 1206_190L 10523.67,2886.15 r90 top value=220uF
C131 "GRM31CR60G227ME11L" 1206_190L 10039.92,2886.05 r90 bottom value=220uF
C132 "GRM31CR60G227ME11L" 1206_190L 10136.66,2886.05 r90 bottom value=220uF
C133 "GRM31CR60G227ME11L" 1206_190L 8129.85,3005.62 r180 bottom value=220uF
C134 "GRM31CR60G227ME11L" 1206_190L 7891.38,2907.17 r0 bottom value=220uF
C135 "GRM31CR60G227ME11L" 1206_190L 7891.38,3005.62 r0 bottom value=220uF
C136 "GRM31CR60G227ME11L" 1206_190L 8388.34,3104.06 r0 bottom value=220uF
C137 "GRM31CR60G227ME11L" 1206_190L 9846.47,2886.15 r90 top value=220uF
C138 "GRM31CR60G227ME11L" 1206_190L 9943.21,2886.15 r90 top value=220uF
C139 "GRM31CR60G227ME11L" 1206_190L 9652.98,2886.15 r90 top value=220uF
C140 "GRM31CR60G227ME11L" 1206_190L 9556.24,2886.15 r90 top value=220uF
C141 "GRM31CR60G227ME11L" 1206_190L 10039.95,2886.15 r90 top value=220uF
C142 "GRM31CR60G227ME11L" 1206_190L 8129.85,3005.62 r180 top value=220uF
C143 "GRM31CR60G227ME11L" 1206_190L 10136.7,2886.15 r90 top value=220uF
C144 "GRM31CR60G227ME11L" 1206_190L 8388.34,3202.51 r0 top value=220uF
C145 "GRM31CR60G227ME11L" 1206_190L 8388.34,3104.06 r0 top value=220uF
C146 "GRM31CR60G227ME11L" 1206_190L 10813.9,2886.15 r90 top value=220uF
C147 "GRM31CR60G227ME11L" 1206_190L 8129.85,2907.17 r180 top value=220uF
C148 "GRM31CR60G227ME11L" 1206_190L 10717.16,2886.15 r90 top value=220uF
C149 "GRM31CR60G227ME11L" 1206_190L 9749.69,2886.05 r90 bottom value=220uF
C150 "GRM31CR60G227ME11L" 1206_190L 9846.43,2886.05 r90 bottom value=220uF
C151 "GRM31CR60G227ME11L" 1206_190L 9943.17,2886.05 r90 bottom value=220uF
C152 "GRM31CR60G227ME11L" 1206_190L 9652.94,2886.05 r90 bottom value=220uF
C153 "GRM31CR60G227ME11L" 1206_190L 9556.2,2886.05 r90 bottom value=220uF
C154 "GRM31CR60G227ME11L" 1206_190L 8388.34,3202.51 r0 bottom value=220uF
C155 "GRM31CR60G227ME11L" 1206_190L 7891.38,3005.62 r0 top value=220uF
C156 "GRM31CR60G227ME11L" 1206_190L 8129.85,2907.17 r180 bottom value=220uF
C157 "GRM31CR60G227ME11L" 1206_190L 10813.86,2886.05 r90 bottom value=220uF
C158 "GRM31CR60G227ME11L" 1206_190L 10717.12,2886.05 r90 bottom value=220uF
C159 "GRM31CR60G227ME11L" 1206_190L 8388.34,3005.62 r0 bottom value=220uF
C160 "GRM31CR60G227ME11L" 1206_190L 8388.34,2907.17 r0 bottom value=220uF
C161 "GRM31CR60G227ME11L" 1206_190L 10620.38,2886.05 r90 bottom value=220uF
C162 "GRM31CR60G227ME11L" 1206_190L 10523.63,2886.05 r90 bottom value=220uF
C163 "GRM31CR60G227ME11L" 1206_190L 10233.44,2886.15 r90 top value=220uF
C164 "GRM31CR60G227ME11L" 1206_190L 9749.72,2886.15 r90 top value=220uF
C165 "GRM31CR60G227ME11L" 1206_190L 10426.93,2886.15 r90 top value=220uF
C166 "GRM31CR60G227ME11L" 1206_190L 10330.18,2886.15 r90 top value=220uF
C167 "GRM31CR60G227ME11L" 1206_190L 10233.4,2886.05 r90 bottom value=220uF
C168 "GRM31CR60G227ME11L" 1206_190L 10426.89,2886.05 r90 bottom value=220uF
C169 "GRM31CR60G227ME11L" 1206_190L 10330.15,2886.05 r90 bottom value=220uF
C170 "GRM31CR60G227ME11L" 1206_190L 7891.38,2907.17 r0 top value=220uF
C171 "GRM155R71H102KA01D" 0402S 5431.78,3902.59 r0 bottom value=1000pF
C172 "EEF-GX0E471R" GX_2TERM 5153.62,3347.92 r0 top value=470uF
C173 "GRM31CR60G227ME11L" 1206_190L 5464.93,3176.8 r180 top value=220uF
C174 "GRM31CR60G227ME11L" 1206_190L 5234.95,3176.81 r0 top value=220uF
C175 "GRM31CR60G227ME11L" 1206_190L 5464.93,3077.4 r180 top value=220uF
C176 "GRM31CR60G227ME11L" 1206_190L 5234.95,2886.26 r0 top value=220uF
C177 "EEF-GX0E471R" GX_2TERM 5153.62,3347.91 r0 bottom value=470uF
C178 "GRM155C81E105KE11D" FP-GRM155C81E105KE11D_0402-MFG 5430.79,4049.49 r270 top
C179 "Capacitor" 0805L 5497.56,4046.31 r270 bottom value=22uF
C180 "Capacitor" 0805L 5426.85,4046.31 r270 bottom value=22uF
C181 "Capacitor" 0805L 5405.21,4338.59 r180 bottom value=22uF
C182 "GCM155R71H104KE02D" 0402S 5129.1,4177 r0 top value=0.1uF
C183 "Capacitor" 0402S 5148.25,4056.26 r270 top value=2.2uF
C184 "Capacitor" 0402S 5148.25,4119.23 r90 top value=2.2uF
C185 "Capacitor" 0402S 5199.29,4224.65 r270 bottom value=100pF
C186 "GCM155R71H104KE02D" 0402S 5343.53,4244.47 r270 top value=0.1uF
C187 "GRM155R71H102KA01D" 0402S 5845.09,3900.84 r0 bottom value=1000pF
C188 "EEF-GX0E471R" GX_2TERM 5569.35,3347.92 r180 bottom value=470uF
C189 "GRM31CR60G227ME11L" 1206_190L 6046.81,2978.77 r0 top value=220uF
C190 "GRM31CR60G227ME11L" 1206_190L 6046.81,3078.58 r0 top value=220uF
C191 "GRM31CR60G227ME11L" 1206_190L 6046.81,2878.97 r0 top value=220uF
C192 "GRM31CR60G227ME11L" 1206_190L 6046.81,3178.38 r0 top value=220uF
C193 "EEF-GX0E471R" GX_2TERM 5569.35,3347.92 r180 top value=470uF
C194 "GRM155C81E105KE11D" FP-GRM155C81E105KE11D_0402-MFG 5862.83,4047.21 r270 top
C195 "Capacitor" 0805L 5852.98,4048.38 r270 bottom value=22uF
C196 "Capacitor" 0805L 5922.91,4048.44 r270 bottom value=22uF
C197 "Capacitor" 0805L 5811.69,4191.41 r180 bottom value=22uF
C198 "Capacitor" 0402S 5576.35,4128.13 r90 top value=2.2uF
C199 "GCM155R71H104KE02D" 0402S 5569.14,4179.93 r0 top value=0.1uF
C200 "Capacitor" 0402S 5575.85,4046.11 r270 top value=2.2uF
C201 "Capacitor" 0402S 5662.52,4245.93 r270 top value=100pF
C202 "GCM155R71H104KE02D" 0402S 5766.57,4245.93 r270 top value=0.1uF
C203 "GRM155R71H102KA01D" 0402S 6261,3894.5 r0 bottom value=1000pF
C204 "EEF-GX0E471R" GX_2TERM 5979.95,3347.92 r0 top value=470uF
C205 "GRM31CR60G227ME11L" 1206_190L 6872.74,3088.38 r0 top value=220uF
C206 "GRM31CR60G227ME11L" 1206_190L 6310.27,3178.38 r180 top value=220uF
C207 "GRM31CR60G227ME11L" 1206_190L 6310.27,2978.77 r180 top value=220uF
C208 "GRM31CR60G227ME11L" 1206_190L 6872.74,3183.65 r0 top value=220uF
C209 "EEF-GX0E471R" GX_2TERM 5979.95,3347.92 r0 bottom value=470uF
C210 "GRM155C81E105KE11D" FP-GRM155C81E105KE11D_0402-MFG 6261.72,4050.99 r270 top
C211 "Capacitor" 0805L 6223.15,4177.06 r180 bottom value=22uF
C212 "Capacitor" 0805L 6332.03,4047.88 r270 bottom value=22uF
C213 "Capacitor" 0805L 6264.02,4047.73 r270 bottom value=22uF
C214 "Capacitor" 0402S 5990.53,4042.58 r270 top value=2.2uF
C215 "Capacitor" 0402S 5990.53,4126.22 r90 top value=2.2uF
C216 "GCM155R71H104KE02D" 0402S 5993.94,4190.43 r0 top value=0.1uF
C217 "Capacitor" 0402S 6113.48,4247.16 r270 top value=100pF
C218 "GCM155R71H104KE02D" 0402S 6182,4247.16 r270 top value=0.1uF
C219 "GRM155R71H102KA01D" 0402S 6671.87,3894.5 r0 bottom value=1000pF
C220 "EEF-GX0E471R" GX_2TERM 6396.44,3344.67 r180 bottom value=470uF
C221 "GRM31CR60G227ME11L" 1206_190L 7120.5,3082.53 r180 top value=220uF
C222 "GRM31CR60G227ME11L" 1206_190L 6872.74,2993.56 r0 top value=220uF
C223 "GRM31CR60G227ME11L" 1206_190L 7120.5,3183.65 r180 top value=220uF
C224 "GRM31CR60G227ME11L" 1206_190L 7120.5,2981.41 r180 top value=220uF
C225 "EEF-GX0E471R" GX_2TERM 6396.44,3344.67 r180 top value=470uF
C226 "GRM155C81E105KE11D" FP-GRM155C81E105KE11D_0402-MFG 6675.65,4052.89 r270 top
C227 "Capacitor" 0805L 6669.9,4048.44 r270 bottom value=22uF
C228 "Capacitor" 0805L 6736.51,4048.36 r270 bottom value=22uF
C229 "Capacitor" 0805L 6635.45,4189.09 r180 bottom value=22uF
C230 "GCM155R71H104KE02D" 0402S 6403.84,4205.16 r0 top value=0.1uF
C231 "Capacitor" 0402S 6408.21,4048.44 r270 top value=2.2uF
C232 "Capacitor" 0402S 6407.63,4115.03 r90 top value=2.2uF
C233 "Capacitor" 0402S 6527.1,4247.16 r270 top value=100pF
C234 "GCM155R71H104KE02D" 0402S 6596.34,4247.16 r270 top value=0.1uF
C235 "GRM155R71H102KA01D" 0402S 7078.32,3891.41 r0 bottom value=1000pF
C236 "EEF-GX0E471R" GX_2TERM 6813.23,3347.92 r0 top value=470uF
C237 "GRM31CR60G227ME11L" 1206_190L 5234.95,2779.17 r0 top value=220uF
C238 "GRM31CR60G227ME11L" 1206_190L 7401.4,2803.92 r0 top value=220uF
C239 "GRM31CR60G227ME11L" 1206_190L 5464.93,2779.17 r180 top value=220uF
C240 "GRM31CR60G227ME11L" 1206_190L 6872.74,2803.92 r0 top value=220uF
C241 "EEF-GX0E471R" GX_2TERM 7227.98,3348.61 r180 top value=470uF
C242 "GRM155C81E105KE11D" FP-GRM155C81E105KE11D_0402-MFG 7089.45,4046.09 r270 top
C243 "Capacitor" 0805L 7084.34,4050.59 r270 bottom value=22uF
C244 "Capacitor" 0805L 7151.97,4051.06 r270 bottom value=22uF
C245 "Capacitor" 0805L 7064.99,4177.06 r180 bottom value=22uF
C246 "Capacitor" 0402S 6813.67,4048.16 r270 top value=2.2uF
C247 "Capacitor" 0402S 6813.67,4125.96 r90 top value=2.2uF
C248 "GCM155R71H104KE02D" 0402S 6807.07,4177.08 r0 top value=0.1uF
C249 "Capacitor" 0402S 6893.32,4250.49 r270 top value=100pF
C250 "GCM155R71H104KE02D" 0402S 7030.65,4250.49 r270 top value=0.1uF
C251 "GRM155R71H102KA01D" 0402S 7484.9,3891.41 r0 bottom value=1000pF
C252 "EEF-GX0E471R" GX_2TERM 6813.23,3347.92 r0 bottom value=470uF
C253 "GRM31CR60G227ME11L" 1206_190L 7401.4,2899.92 r0 top value=220uF
C254 "GRM31CR60G227ME11L" 1206_190L 7401.4,3091.92 r0 top value=220uF
C255 "GRM31CR60G227ME11L" 1206_190L 7401.4,3187.92 r0 top value=220uF
C256 "GRM31CR60G227ME11L" 1206_190L 7120.5,2779.17 r180 top value=220uF
C257 "EEF-GX0E471R" GX_2TERM 7227.98,3348.61 r180 bottom value=470uF
C258 "GRM155C81E105KE11D" FP-GRM155C81E105KE11D_0402-MFG 7481.29,4048.82 r270 top
C259 "Capacitor" 0805L 7451.05,4181.08 r180 bottom value=22uF
C260 "Capacitor" 0805L 7549.97,4049.71 r270 bottom value=22uF
C261 "Capacitor" 0805L 7483.62,4049.71 r270 bottom value=22uF
C262 "Capacitor" 0402S 7210.42,4034.6 r270 top value=2.2uF
C263 "Capacitor" 0402S 7210.42,4114.91 r90 top value=2.2uF
C264 "GCM155R71H104KE02D" 0402S 7203.28,4186.21 r0 top value=0.1uF
C265 "Capacitor" 0402S 7288.21,4250.49 r270 top value=100pF
C266 "GCM155R71H104KE02D" 0402S 7429.67,4250.49 r270 top value=0.1uF
C267 "GRM155R71H102KA01D" 0402S 7951.01,3893.8 r0 bottom value=1000pF
C268 "EEF-GX0E471R" GX_2TERM 8221.89,3367.06 r180 bottom value=470uF
C269 "GRM31CR60G227ME11L" 1206_190L 8129.85,3202.51 r180 top value=220uF
C270 "GRM31CR60G227ME11L" 1206_190L 7891.38,3202.51 r0 bottom value=220uF
C271 "GRM31CR60G227ME11L" 1206_190L 8129.85,3202.51 r180 bottom value=220uF
C272 "GRM31CR60G227ME11L" 1206_190L 7891.38,3202.51 r0 top value=220uF
C273 "EEF-GX0E471R" GX_2TERM 8221.89,3367.06 r180 top value=470uF
C274 "GRM155C81E105KE11D" FP-GRM155C81E105KE11D_0402-MFG 7956.7,4045.6 r270 top
C275 "Capacitor" 0805L 7955.99,4050.61 r270 bottom value=22uF
C276 "Capacitor" 0805L 8033.75,4049.71 r270 bottom value=22uF
C277 "Capacitor" 0805L 7928.4,4197.7 r180 bottom value=22uF
C278 "GCM155R71H104KE02D" 0402S 7663.31,4186.06 r0 top value=0.1uF
C279 "Capacitor" 0402S 7788.4,4250.1 r270 top value=100pF
C280 "Capacitor" 0402S 7674.72,4039.48 r270 top value=2.2uF
C281 "Capacitor" 0402S 7674.72,4119.56 r90 top value=2.2uF
C282 "GCM155R71H104KE02D" 0402S 7893.26,4250.1 r270 top value=0.1uF
C283 "GRM155R71H102KA01D" 0402S 8392.02,3893.12 r0 bottom value=1000pF
C284 "EEF-GX0E471R" GX_2TERM 7810.67,3367.06 r0 bottom value=470uF
C285 "GRM31CR60G227ME11L" 1206_190L 8129.85,3104.06 r180 top value=220uF
C286 "GRM31CR60G227ME11L" 1206_190L 8129.85,3104.06 r180 bottom value=220uF
C287 "GRM31CR60G227ME11L" 1206_190L 7891.38,3104.06 r0 top value=220uF
C288 "GRM31CR60G227ME11L" 1206_190L 7891.38,3104.06 r0 bottom value=220uF
C289 "EEF-GX0E471R" GX_2TERM 7810.67,3367.06 r0 top value=470uF
C290 "GRM155C81E105KE11D" FP-GRM155C81E105KE11D_0402-MFG 8400.4,4048.36 r270 top
C291 "Capacitor" 0805L 8405.41,4051.33 r270 bottom value=22uF
C292 "Capacitor" 0805L 8474.44,4050.61 r270 bottom value=22uF
C293 "Capacitor" 0805L 8361.06,4186.1 r180 bottom value=22uF
C294 "Capacitor" 0402S 8125.2,4125.38 r90 top value=2.2uF
C295 "GCM155R71H104KE02D" 0402S 8107.66,4181.79 r0 top value=0.1uF
C296 "Capacitor" 0402S 8125.2,4037.46 r270 top value=2.2uF
C297 "Capacitor" 0402S 8216.62,4250.1 r270 top value=100pF
C298 "GCM155R71H104KE02D" 0402S 8354.93,4250.1 r270 top value=0.1uF
C299 "GRM21BR61E226ME44L" 0805L 6078.96,5362.13 r270 top value=22uF
C300 "GRM033R61E104KE14J" 0201_033L 5940.69,5529.9 r0 top value=0.1uF
C301 "GRM21BR60J107M" 0805L 5778.32,4750.47 r180 top value=100uF
C302 "GRM21BR60J107M" 0805L 6031.73,4823.36 r0 top value=100uF
C303 "GRM21BR60J107M" 0805L 5778.32,4823.36 r180 top value=100uF
C304 "GRM188R61A226ME15D" 0603S 6029.34,4643.23 r180 top value=22uF
C305 "GRM188R61A226ME15D" 0603S 6028.6,4591.78 r180 top value=22uF
C306 "GRM21BR60J107M" 0805L 6031.6,4750.82 r0 top value=100uF
C307 "GRM21BR61E226ME44L" 0805L 5628.03,5357.17 r270 top value=22uF
C308 "GRM033R61E104KE14J" 0201_033L 5824.15,5532.63 r180 top value=0.1uF
C309 "GRM21BR60J107M" 0805L 5573.67,4754.21 r0 top value=100uF
C310 "GRM21BR60J107M" 0805L 5573.67,4823.36 r0 top value=100uF
C311 "GRM21BR60J107M" 0805L 5320.47,4823.36 r180 top value=100uF
C312 "GRM21BR60J107M" 0805L 5320.47,4677.57 r180 top value=100uF
C313 "GRM21BR60J107M" 0805L 5573.67,4685.11 r0 top value=100uF
C314 "GRM188R61A226ME15D" 0603S 5578.39,4624.7 r180 top value=22uF
C315 "GRM188R61A106KAALD" 0603S 5578.7,4576.79 r180 top value=10uF
C316 "GRM21BR60J107M" 0805L 5320.47,4604.67 r180 top value=100uF
C317 "GRM21BR61E226ME44L" 0805L 6206.32,6209.64 r270 top value=22uF
C318 "GRM033R61E104KE14J" 0201_033L 5987.93,5963.43 r0 top value=0.1uF
C319 "GRM188R61A226ME15D" 0603S 5451.71,6182.17 r90 top value=22uF
C320 "GRM21BR61A476ME15L" 0805L 5521.8,6430.86 r90 top value=47uF
C321 "GRM21BR61A476ME15L" 0805L 5520.6,6182.17 r270 top value=47uF
C322 "GRM188R61A226ME15D" 0603S 5450.39,6430.86 r270 top value=22uF
C323 "GRM188R61A226ME15D" 0603S 5393.85,6430.86 r270 top value=22uF
C324 "GRM188R61A226ME15D" 0603S 5392.65,6180.66 r90 top value=22uF
C325 "GRM155R61A475M" 0402S 5337.4,6180.11 r270 top value=4.7uF
C326 "GRM188R61A226ME15D" 0603S 5624.77,6100.7 r270 top value=22uF
C327 "GRM188R61A226ME15D" 0603S 5678.34,6100.7 r270 top value=22uF
C328 "GRM188R61A226ME15D" 0603S 5731.9,6100.7 r270 top value=22uF
C329 "GRM188R60J476ME15D" 0603S 5489.13,5595.86 r270 top value=47uF
C330 "GRM188R61A106KAALD" 0603S 5489.13,5719.04 r90 top value=10uF
C331 "GRM188R61A226ME15D" 0603S 5432.59,5595.28 r90 top value=22uF
C332 "GRM188R61A226ME15D" 0603S 5432.59,5719.04 r270 top value=22uF
C333 "GRM188R61A226ME15D" 0603S 5489.13,5932.57 r270 top value=22uF
C334 "GRM188R61A226ME15D" 0603S 5432.59,5810.48 r90 top value=22uF
C335 "GRM188R61A226ME15D" 0603S 5489.13,5810.48 r90 top value=22uF
C336 "TAJE476M035RNJ" 7343-43 6455.78,6120.08 r270 top value=47uF
C337 "GRM155R60J225KE95D" 0402S 5882.42,5572.02 r90 bottom value=2.2uF
C338 "GRM155R60J225KE95D" 0402S 5949.32,6012.24 r90 bottom value=2.2uF
C339 "GRM188R61A106KAALD" 0603S 6043.64,5602.45 r90 bottom value=10uF
C340 "GRM188R61A106KAALD" 0603S 5850.22,6023.76 r90 bottom value=10uF
C341 "GRM188R61A106KAALD" 0603S 5631.3,5764.4 r180 top value=10uF
C342 "C1005X5R1A475K050BC" 0402_065 6188.34,5578.47 r0 top value=4.7uF
C343 "GRM033R61A105ME15D" 0201L#1 5770.22,5533.87 r270 bottom value=1uF
C344 "GRM033R61A105ME15D" 0201L#1 5724.28,5863.93 r180 bottom value=1uF
C345 "GRM155R60J226ME11D" 0402S 6098.3,5527.86 r0 top value=22uF
C346 "GRM033R61E104KE14J" 0201_033L 5690.39,5879.71 r270 bottom value=0.1uF
C347 "GRM033R61E104KE14J" 0201_033L 5718.5,5901.75 r90 bottom value=0.1uF
C348 "GRM155R6YA105ME11D" 0402S 6182.47,5679.26 r0 top value=1uF
C349 "GRM155R6YA105ME11D" 0402S 6201.4,5769.28 r0 top value=1uF
C350 "C1005X5R1A475M050BC" 0402S 6162.51,5669.71 r270 bottom value=4.7uF
C351 "C1005X5R1A475M050BC" 0402S 6231.96,5723.93 r0 top value=4.7uF
C352 "GRM033R61E104KE14J" 0201_033L 6128.7,5666.28 r270 top value=0.1uF
C353 "GRM155R60J475ME87D" 0402_065S 5900.72,6012.19 r90 bottom value=4.7uF
C354 "GRM155R60J475ME87D" 0402_065S 6198.7,5622.6 r0 top value=4.7uF
C355 "GRM155R60J475ME87D" 0402_065S 6102.25,5545.14 r270 bottom value=4.7uF
C356 "GRM033R61C104KE14D" 0201_033L 5744.51,5533.87 r270 bottom value=0.1uF
C357 "CKG57NX5R1E476M500JH" 1206_190L 7131.59,6124.24 r270 top value=47uF
C358 "CKG57NX5R1E476M500JH" 1206_190L 6779.55,6125.14 r270 top value=47uF
C359 "GRM21BR60J107M" 0805L 6879.03,5899.05 r0 top value=100uF
C360 "GRM21BR60J107M" 0805L 7177.89,5982 r0 top value=100uF
C361 "GRM21BR60J107M" 0805L 7179.24,5820.31 r0 top value=100uF
C362 "GRM21BR60J107M" 0805L 7177.89,5899.05 r0 top value=100uF
C363 "GRM21BR60J107M" 0805L 6710.65,5820.31 r180 top value=100uF
C364 "GRM21BR60J107M" 0805L 6710.65,5977.83 r180 top value=100uF
C365 "GRM21BR60J107M" 0805L 7018.33,5820.31 r180 top value=100uF
C366 "GRM21BR60J107M" 0805L 6879.03,5820.31 r0 top value=100uF
C367 "GRM21BR60J107M" 0805L 7018.33,5899.05 r180 top value=100uF
C368 "GRM21BR60J107M" 0805L 6710.65,5899.07 r180 top value=100uF
C369 "GRM155R61E475ME15" 0402 6927.67,6330.29 r0 top value=4.7uF
C370 "C3216JB1E476M160AC" 1206L 6785.45,5506.66 r180 top value=47uF
C371 "C3216JB1E476M160AC" 1206L 6779.55,5144.84 r180 top value=47uF
C372 "GRM21BR60J107M" 0805L 6387.54,5269.02 r90 top value=100uF
C373 "GRM21BR60J107M" 0805L 6632.76,5072.04 r0 top value=100uF
C374 "GRM21BR60J107M" 0805L 6461.98,5269.02 r90 top value=100uF
C375 "GRM21BR60J107M" 0805L 6632.76,5151.73 r0 top value=100uF
C376 "GRM21BR60J107M" 0805L 6540.99,5268.57 r90 top value=100uF
C377 "GRM21BR60J107M" 0805L 6461.9,5393.65 r270 top value=100uF
C378 "GRM21BR60J107M" 0805L 6540.91,5393.15 r270 top value=100uF
C379 "GRM21BR60J107M" 0805L 6387.46,5393.65 r270 top value=100uF
C380 "GRM21BR60J107M" 0805L 6631.91,5499.77 r0 top value=100uF
C381 "GRM21BR60J107M" 0805L 6633.76,5574.06 r0 top value=100uF
C382 "GRM155R61E475ME15" 0402S 6974.96,5324.15 r270 top value=4.7uF
C383 "C3216JB1E476M160AC" 1206L 7720.31,6125.14 r270 top value=47uF
C384 "C3216JB1E476M160AC" 1206L 7367.4,6123.45 r270 top value=47uF
C385 "GRM21BR60J107M" 0805L 7620.98,5890.39 r180 top value=100uF
C386 "GRM21BR60J107M" 0805L 7720.31,5976.24 r90 top value=100uF
C387 "GRM21BR60J107M" 0805L 7364.53,5976.24 r90 top value=100uF
C388 "GRM21BR60J107M" 0805L 7487.31,5893.34 r0 top value=100uF
C389 "GRM155R61E475ME15" 0402S 7533.82,6320.04 r0 top value=4.7uF
C390 "GRM21BR60J107M" 0805L 7621.15,5737.26 r180 top value=100uF
C391 "GRM21BR60J107M" 0805L 7795.69,5975.41 r90 top value=100uF
C392 "GRM21BR60J107M" 0805L 7619.95,5814.36 r180 top value=100uF
C393 "GRM21BR60J107M" 0805L 7289.21,5976.24 r90 top value=100uF
C394 "GRM21BR60J107M" 0805L 7487.71,5737.44 r0 top value=100uF
C395 "GRM21BR60J107M" 0805L 7488.11,5815.34 r0 top value=100uF
C396 "GRM188R61A226ME15D" 0603S 5432.59,5932.57 r270 top value=22uF
C397 "GRM155R60J226ME11D" 0402S 6098.14,5488.13 r0 top value=22uF
C398 "GRM21BR60J107M" 0805L 5320.47,4750.47 r180 top value=100uF
C399 "GRM21BR60J107M" 0805L 5778.32,4677.57 r180 top value=100uF
C400 "GRM21BR60J107M" 0805L 5778.32,4604.67 r180 top value=100uF
C401 "GRM188R61A106KAALD" 0603S 6028.6,4694.68 r180 top value=10uF
D1 "MBR0530T1G" SOD-123 3669.36,1590.83 r180 top value=30V
D2 "MBR0530T1G" SOD-123 3659.52,2010.99 r180 bottom value=30V
D3 "LTST-C170KRKT" LED_LTST-C170_Red 3651.5,1482.56 r0 top value=Red
D4 "MBR0530T1G" SOD-123 3675.5,1699.1 r0 top value=30V
D5 "MBR0530T1G" SOD-123 3659.52,1897.38 r0 bottom value=30V
D6 "LTST-C170KRKT" LED_LTST-C170_Red 3640.48,2178.06 r0 top value=Red
D7 "BAT54-7-F" SOT-23 3185.24,2299.49 r90 top value=30V
D8 "MBR0530T1G" SOD-123 9173.37,2029.32 r0 top value=30V
D9 "MBR0530T1G" SOD-123 9173.37,1807.71 r0 bottom value=30V
D10 "LTST-C170KRKT" LED_LTST-C170_Red 9379.71,1992.18 r90 top value=Red
D11 "MBR0530T1G" SOD-123 9173.37,1921.05 r180 top value=30V
D12 "MBR0530T1G" SOD-123 9170.31,1701.29 r180 bottom value=30V
D13 "LTST-C170KRKT" LED_LTST-C170_Red 9198.85,1464.28 r180 top value=Red
D14 "LTST-C170KGKT" LTST-C170KGKT_Green 4197,4563.54 r180 top value=Green
D15 "LTST-C170KGKT" LTST-C170KGKT_Green 4197,4353.9 r180 top value=Green
D16 "LTST-C170KGKT" LTST-C170KGKT_Green 4197,4140.5 r180 top value=Green
D17 "LTST-C170KGKT" LTST-C170KGKT_Green 4197,3872 r180 top value=Green
D18 "LTST-C170KRKT" LED_LTST-C170_Red 4194.17,3661.08 r0 top value=Red
H1 "NY PMS 440 0025 PH" "NY PMS 440 0025 PH" 10883.6,7416.5 r0 top
H2 "1902C" Keystone_1902C 10883.6,7416.5 r180 bottom
H3 "NY PMS 440 0025 PH" "NY PMS 440 0025 PH" 1370.5,7516.5 r0 top
H4 "1902C" Keystone_1902C 10971,1277.9 r180 bottom
H5 "NY PMS 440 0025 PH" "NY PMS 440 0025 PH" 263.7,283.3 r0 top
H6 "1902C" Keystone_1902C 1370.5,7516.5 r180 bottom
H7 "NY PMS 440 0025 PH" "NY PMS 440 0025 PH" 10971.8,1277.7 r0 top
H8 "1902C" Keystone_1902C 263.7,283.3 r180 bottom
J1 "22284043" Molex_0022284043 1891.9,7537 r180 top
J2 "TSW-102-07-G-S" TSW-102-07-G-S 4618.2,4319 r90 top
J3 "TSW-102-07-G-S" TSW-102-07-G-S 4618.2,4584.8 r90 top
J4 "22284043" Molex_0022284043 3385.2,7019.8 r270 top
J5 "TSW-102-07-G-S" TSW-102-07-G-S 3674.1,5364 r0 top
J6 "TSW-102-07-G-S" TSW-102-07-G-S 3675.54,5494.2 r180 top
J7 "5103308-1" CONN_5103308-1 9782.3,5243.1 r270 top
J8 "TSW-102-07-G-S" TSW-102-07-G-S 3198.77,1502.25 r270 top
J9 "HSEC8-130-01-L-DV-A" controlCARD-180HSEC-60pinAddon 6457.15,2437.15 r180 top
J10 "HSEC8-130-01-L-DV-A" controlCARD-180HSEC-60pinAddon 10184.32,3180.11 r180 top
J11 "131-3711-201" Johnson_131-3711-201 2833.24,2430.69 r90 top
J12 "131-3711-201" Johnson_131-3711-201 9258,2277.01 r270 top
J13 "1935776" Phoenix_1935776 2550.3,310.77 r0 top
J14 "1935776" Phoenix_1935776 3489.35,307.97 r0 top
J15 "1935776" Phoenix_1935776 364.2,1754.68 r270 top
J16 "1935776" Phoenix_1935776 364.2,945.98 r270 top
J17 "1935776" Phoenix_1935776 1671.17,310.1 r0 top
J18 "1935776" Phoenix_1935776 737.57,310.1 r0 top
J19 "TSM-104-01-L-DV" Samtec_TSM-104-01-x-DV 4443.26,5876.1 r0 top
J20 "61000218321" Wurth_61000218321 4665.3,5516.3 r90 top
J21 "61000218321" Wurth_61000218321 4931.74,5291.5 r90 top
J22 "61000218321" Wurth_61000218321 4932.7,5516.3 r90 top
J23 "52745-0633" Molex_52745-0633 2657.7,7538.11 r180 top
J24 "TSW-102-07-G-S" TSW-102-07-G-S 4245.1,6504.5 r0 top
J25 "TSM-103-01-L-DV" Samtec_TSM-103-01-x-DV 9740.9,6096.9 r0 top
J26 "CMP-0055448-2" CONN_2510-6002 3874.8,7588.7 r180 top
J27 "TSM-103-01-L-DV" Samtec_TSM-103-01-x-DV 9740.9,6450.6 r0 top
J28 "SL 11 112 03G" Fischer_SL-11-112-03G 9736.5,6830.2 r270 top
J29 "TSW-102-07-G-S" TSW-102-07-G-S 2746.5,7334 r0 top
J30 "1935776" Phoenix_1935776 364.2,6606.9 r270 top
J31 "1935776" Phoenix_1935776 364.2,7415.6 r270 top
J32 "TSW-102-07-G-S" TSW-102-07-G-S 3945.7,2839.5 r0 top
J33 "1935776" Phoenix_1935776 364.2,5798.19 r270 top
J34 "1935776" Phoenix_1935776 364.2,2563.38 r270 top
J35 "1935776" Phoenix_1935776 364.2,3372.09 r270 top
J36 "1935776" Phoenix_1935776 364.2,4989.49 r270 top
J37 "1935776" Phoenix_1935776 364.2,4180.79 r270 top
J38 "TSW-102-07-G-S" TSW-102-07-G-S 3945.7,2973.7 r0 top
J39 "TSW-102-07-G-S" TSW-102-07-G-S 3945.7,3107.9 r0 top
